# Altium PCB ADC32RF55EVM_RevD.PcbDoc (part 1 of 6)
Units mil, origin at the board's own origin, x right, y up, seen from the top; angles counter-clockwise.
Board outline 4190 x 2750 mil, 14 copper layers (Top Copper, Layer 2 (GND1), Layer 3 (PWR1), Layer 4 (GND2, Layer 5 (PWR2), Layer 6 (GND3), Layer 7 (SIG1), Layer 8 (GND4), Layer 9 (GND5), Layer 10 (SIG2), Layer 11 (GND6), Layer 12 (PWR3), Layer 13 (GND7), Bottom Copper), stack 58.6 mil thick; 427 components, 558 nets, 1902 pads, 1008 vias.
Unrouted connection lines stored in the file: 51.
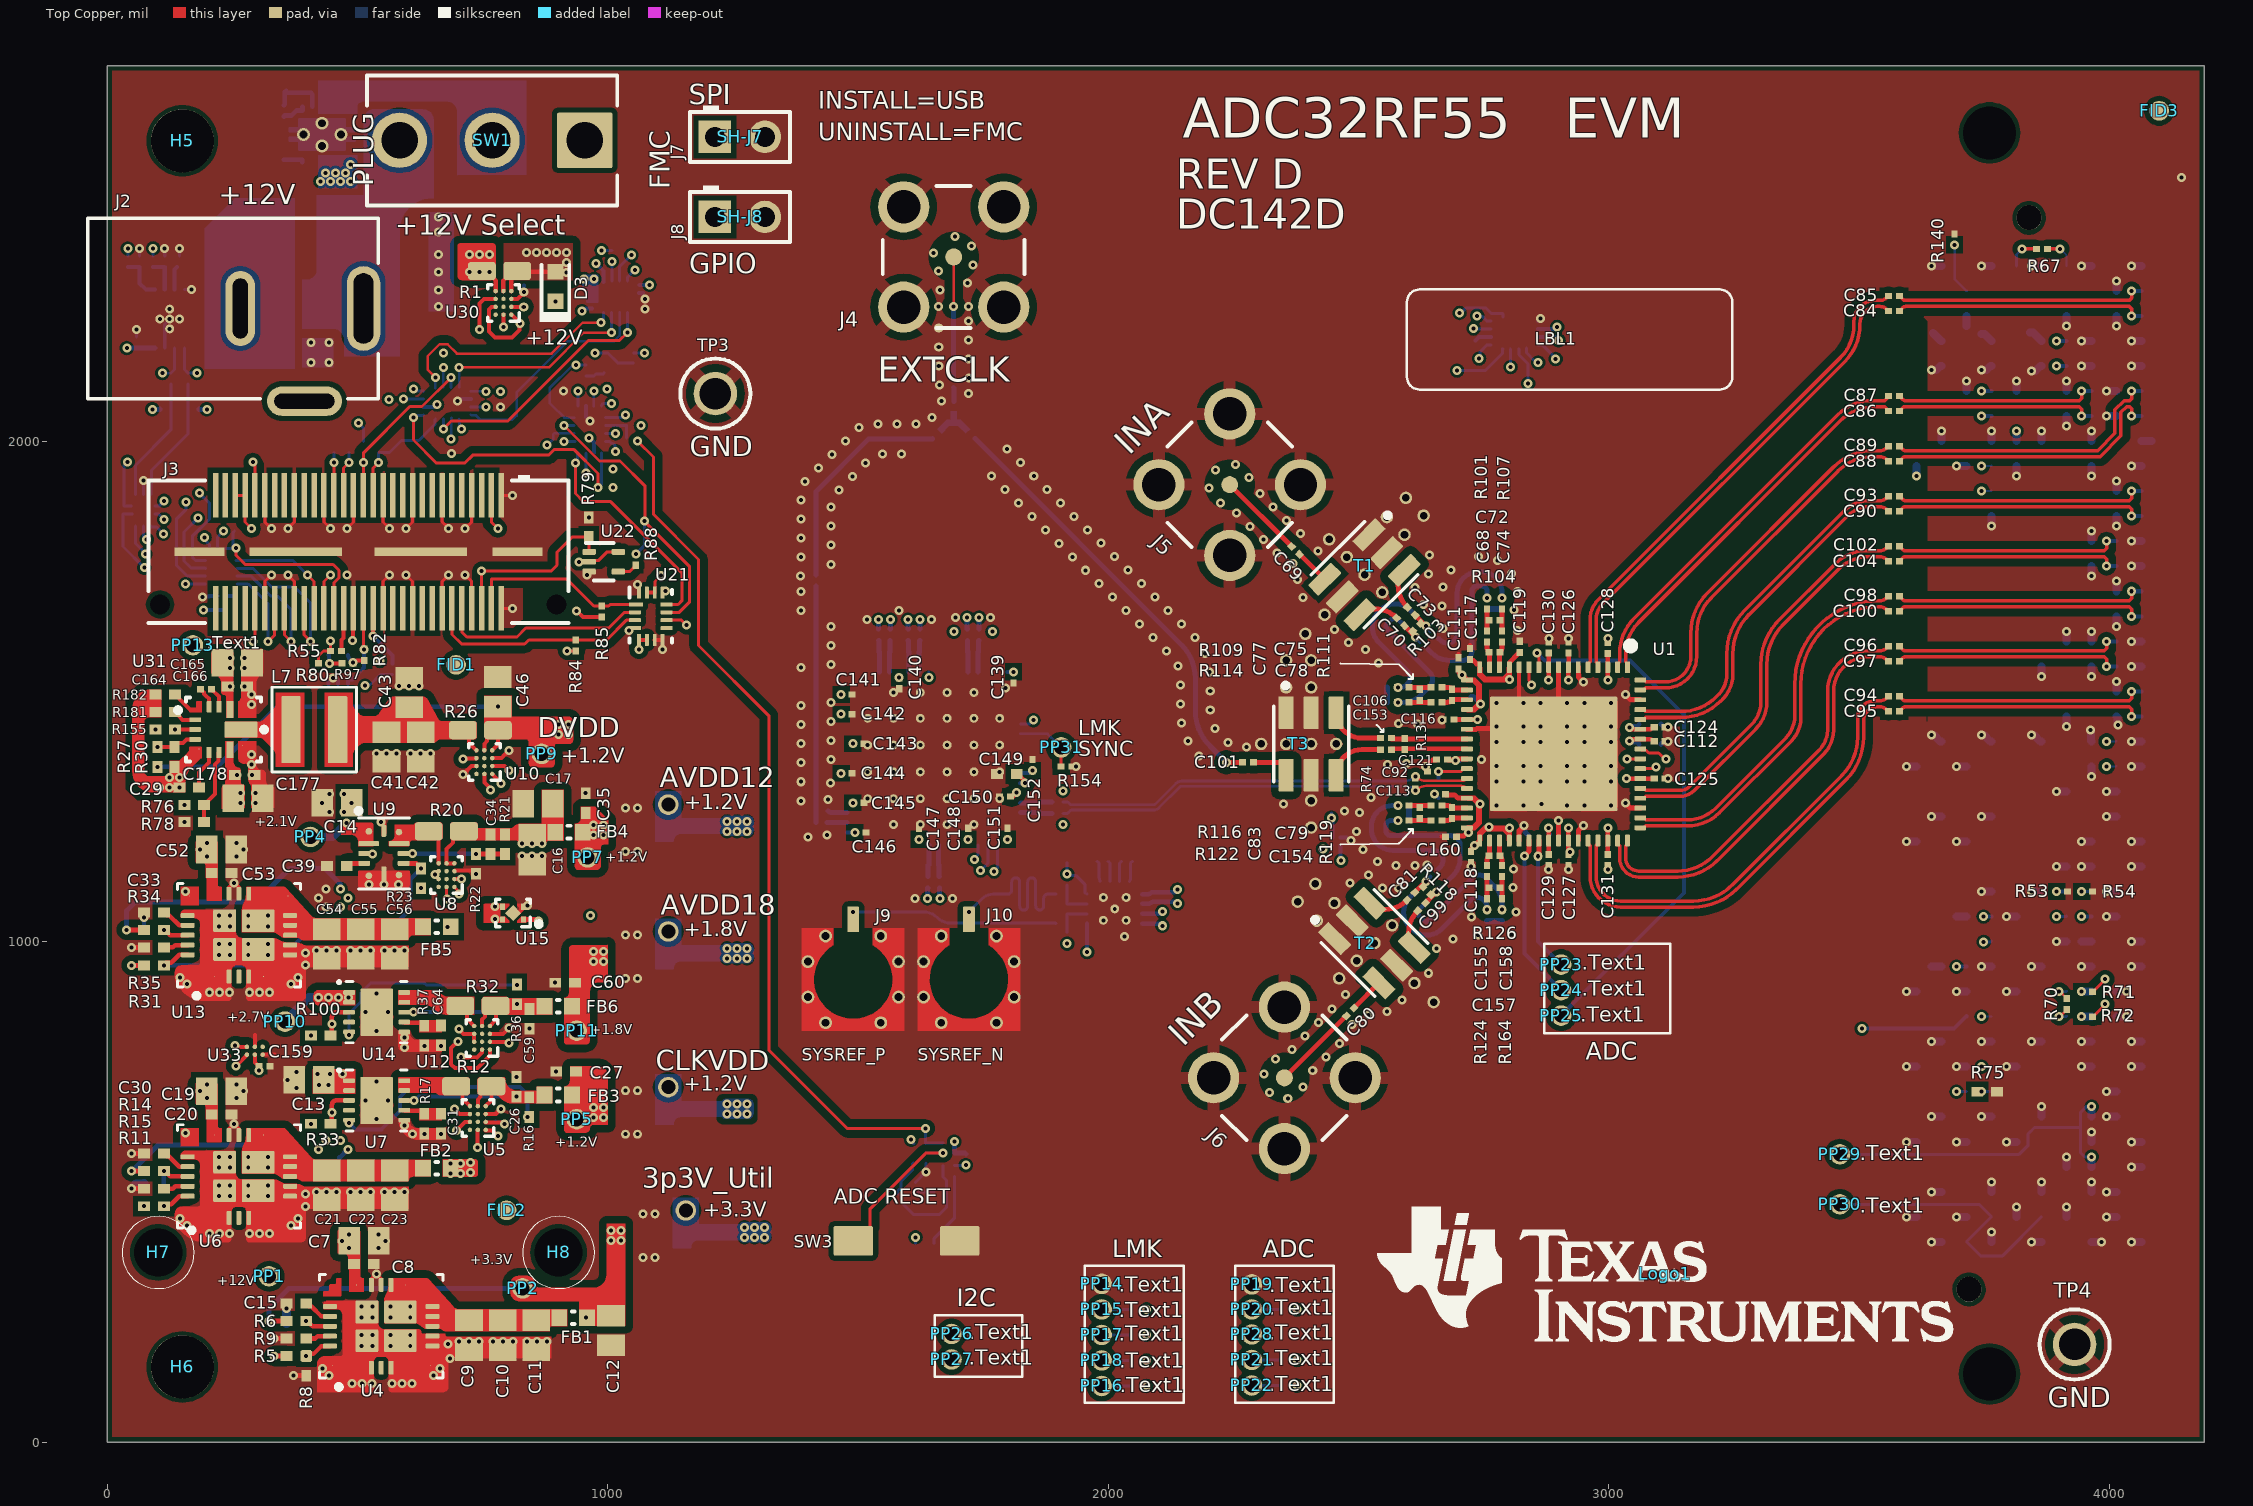
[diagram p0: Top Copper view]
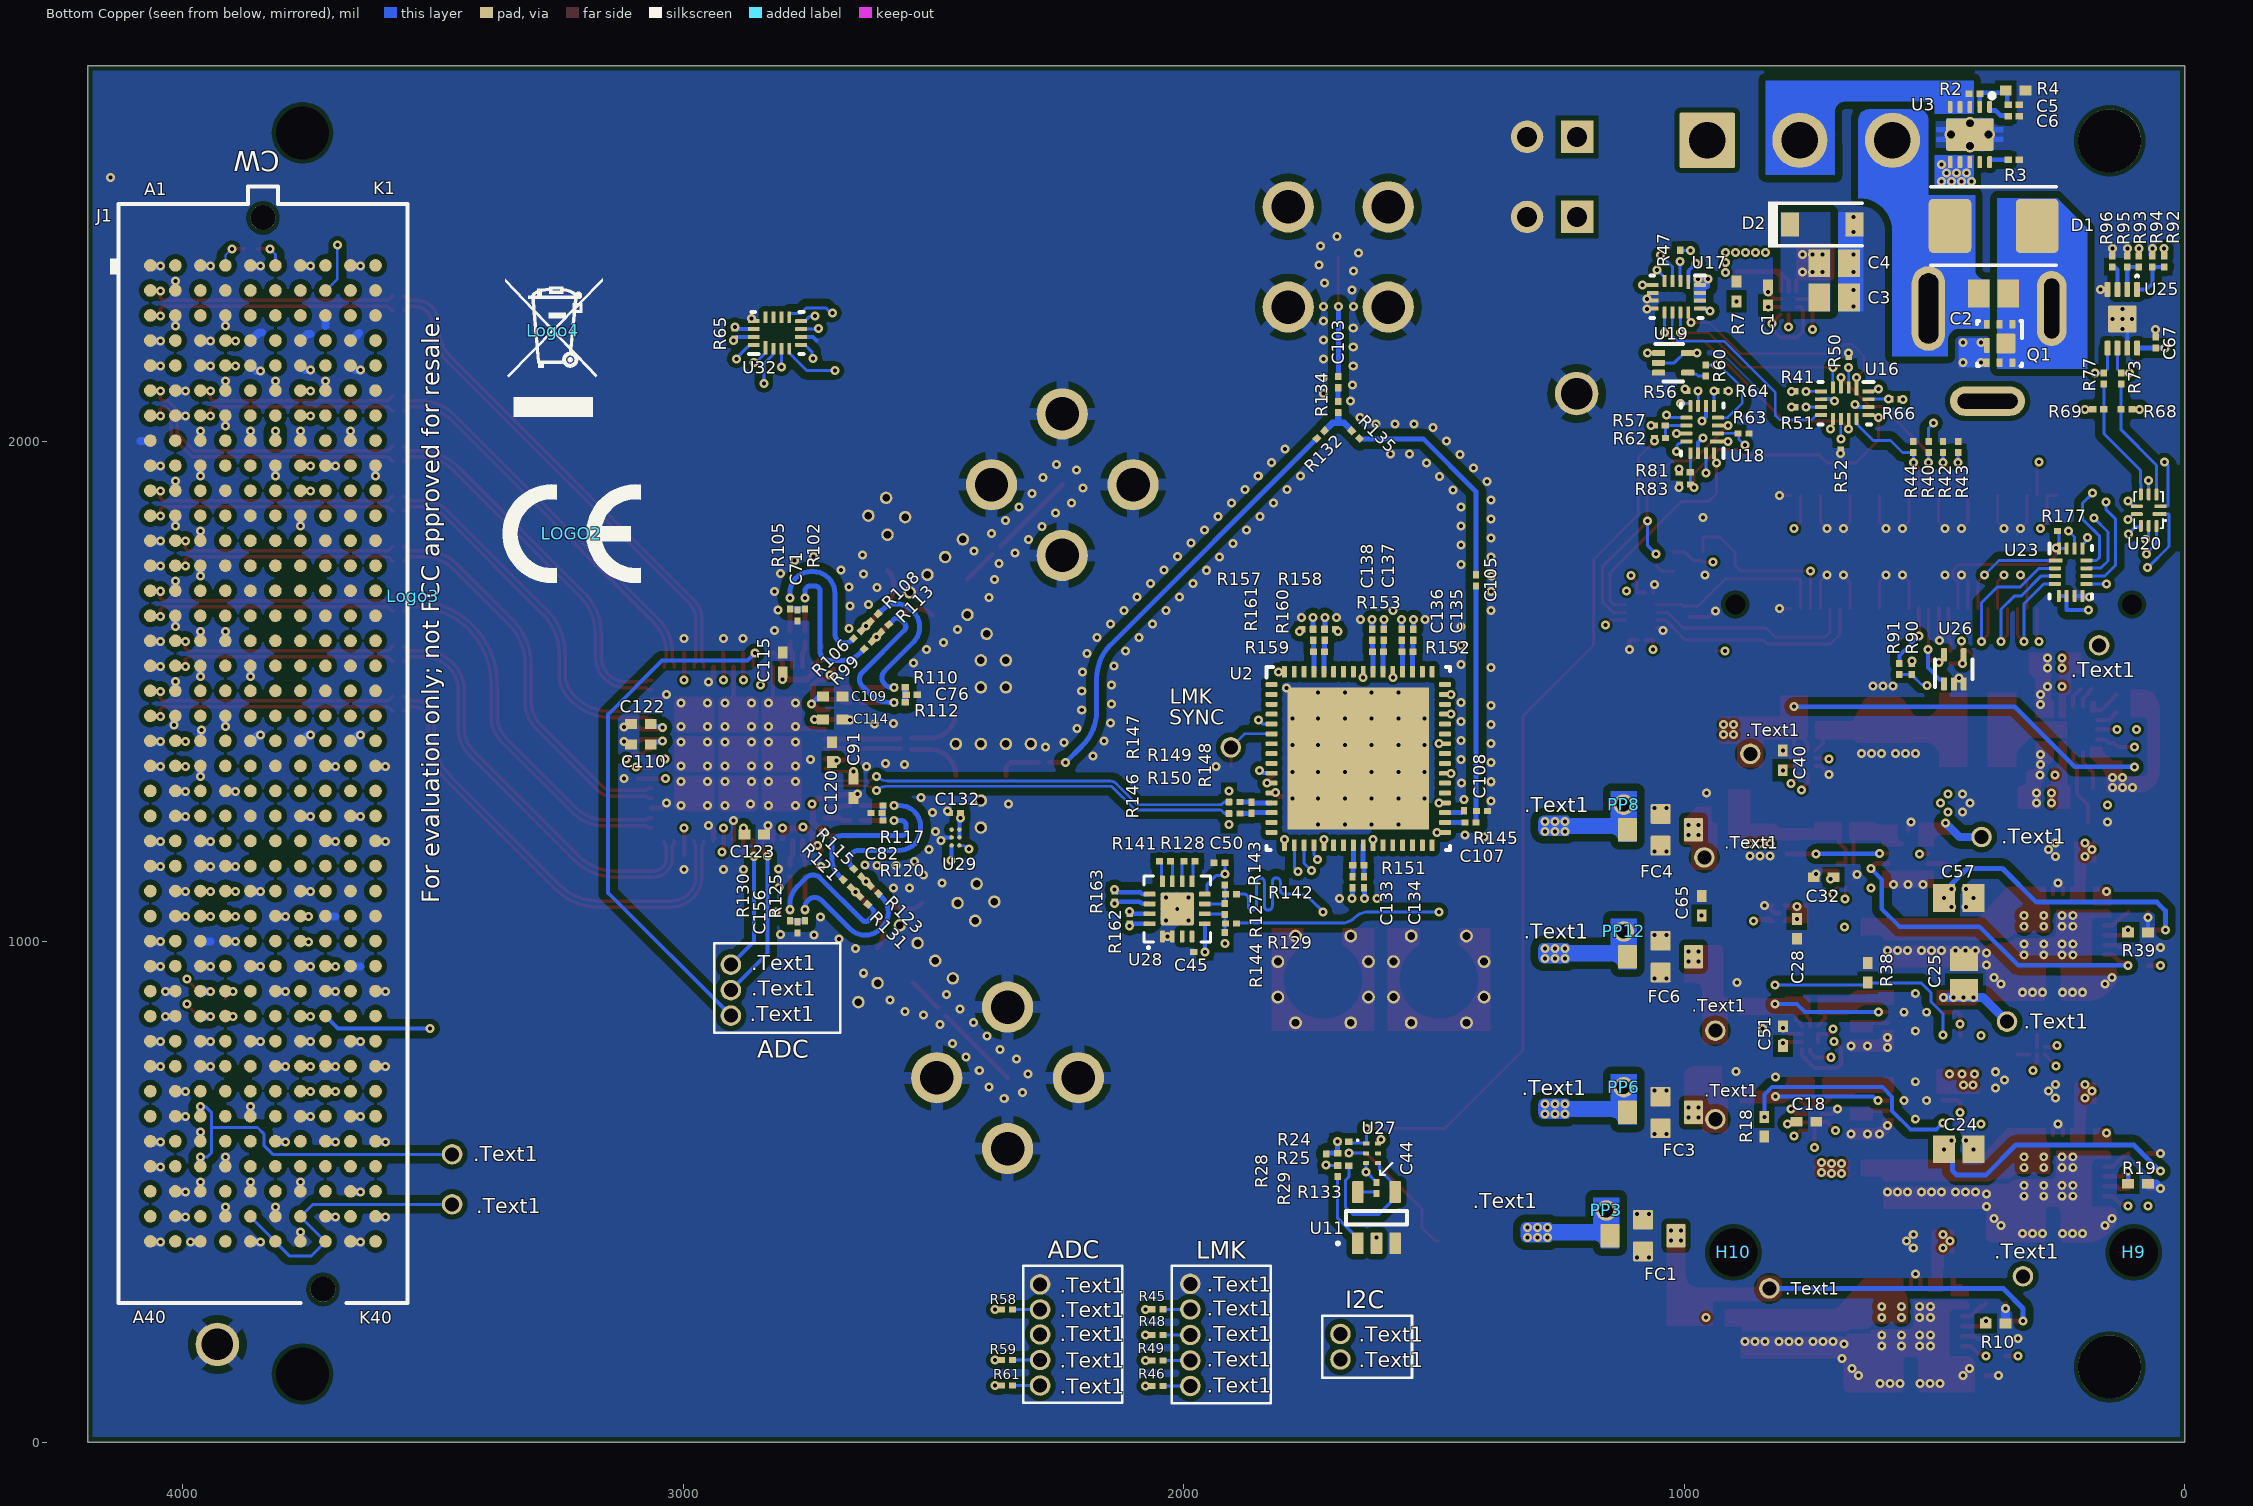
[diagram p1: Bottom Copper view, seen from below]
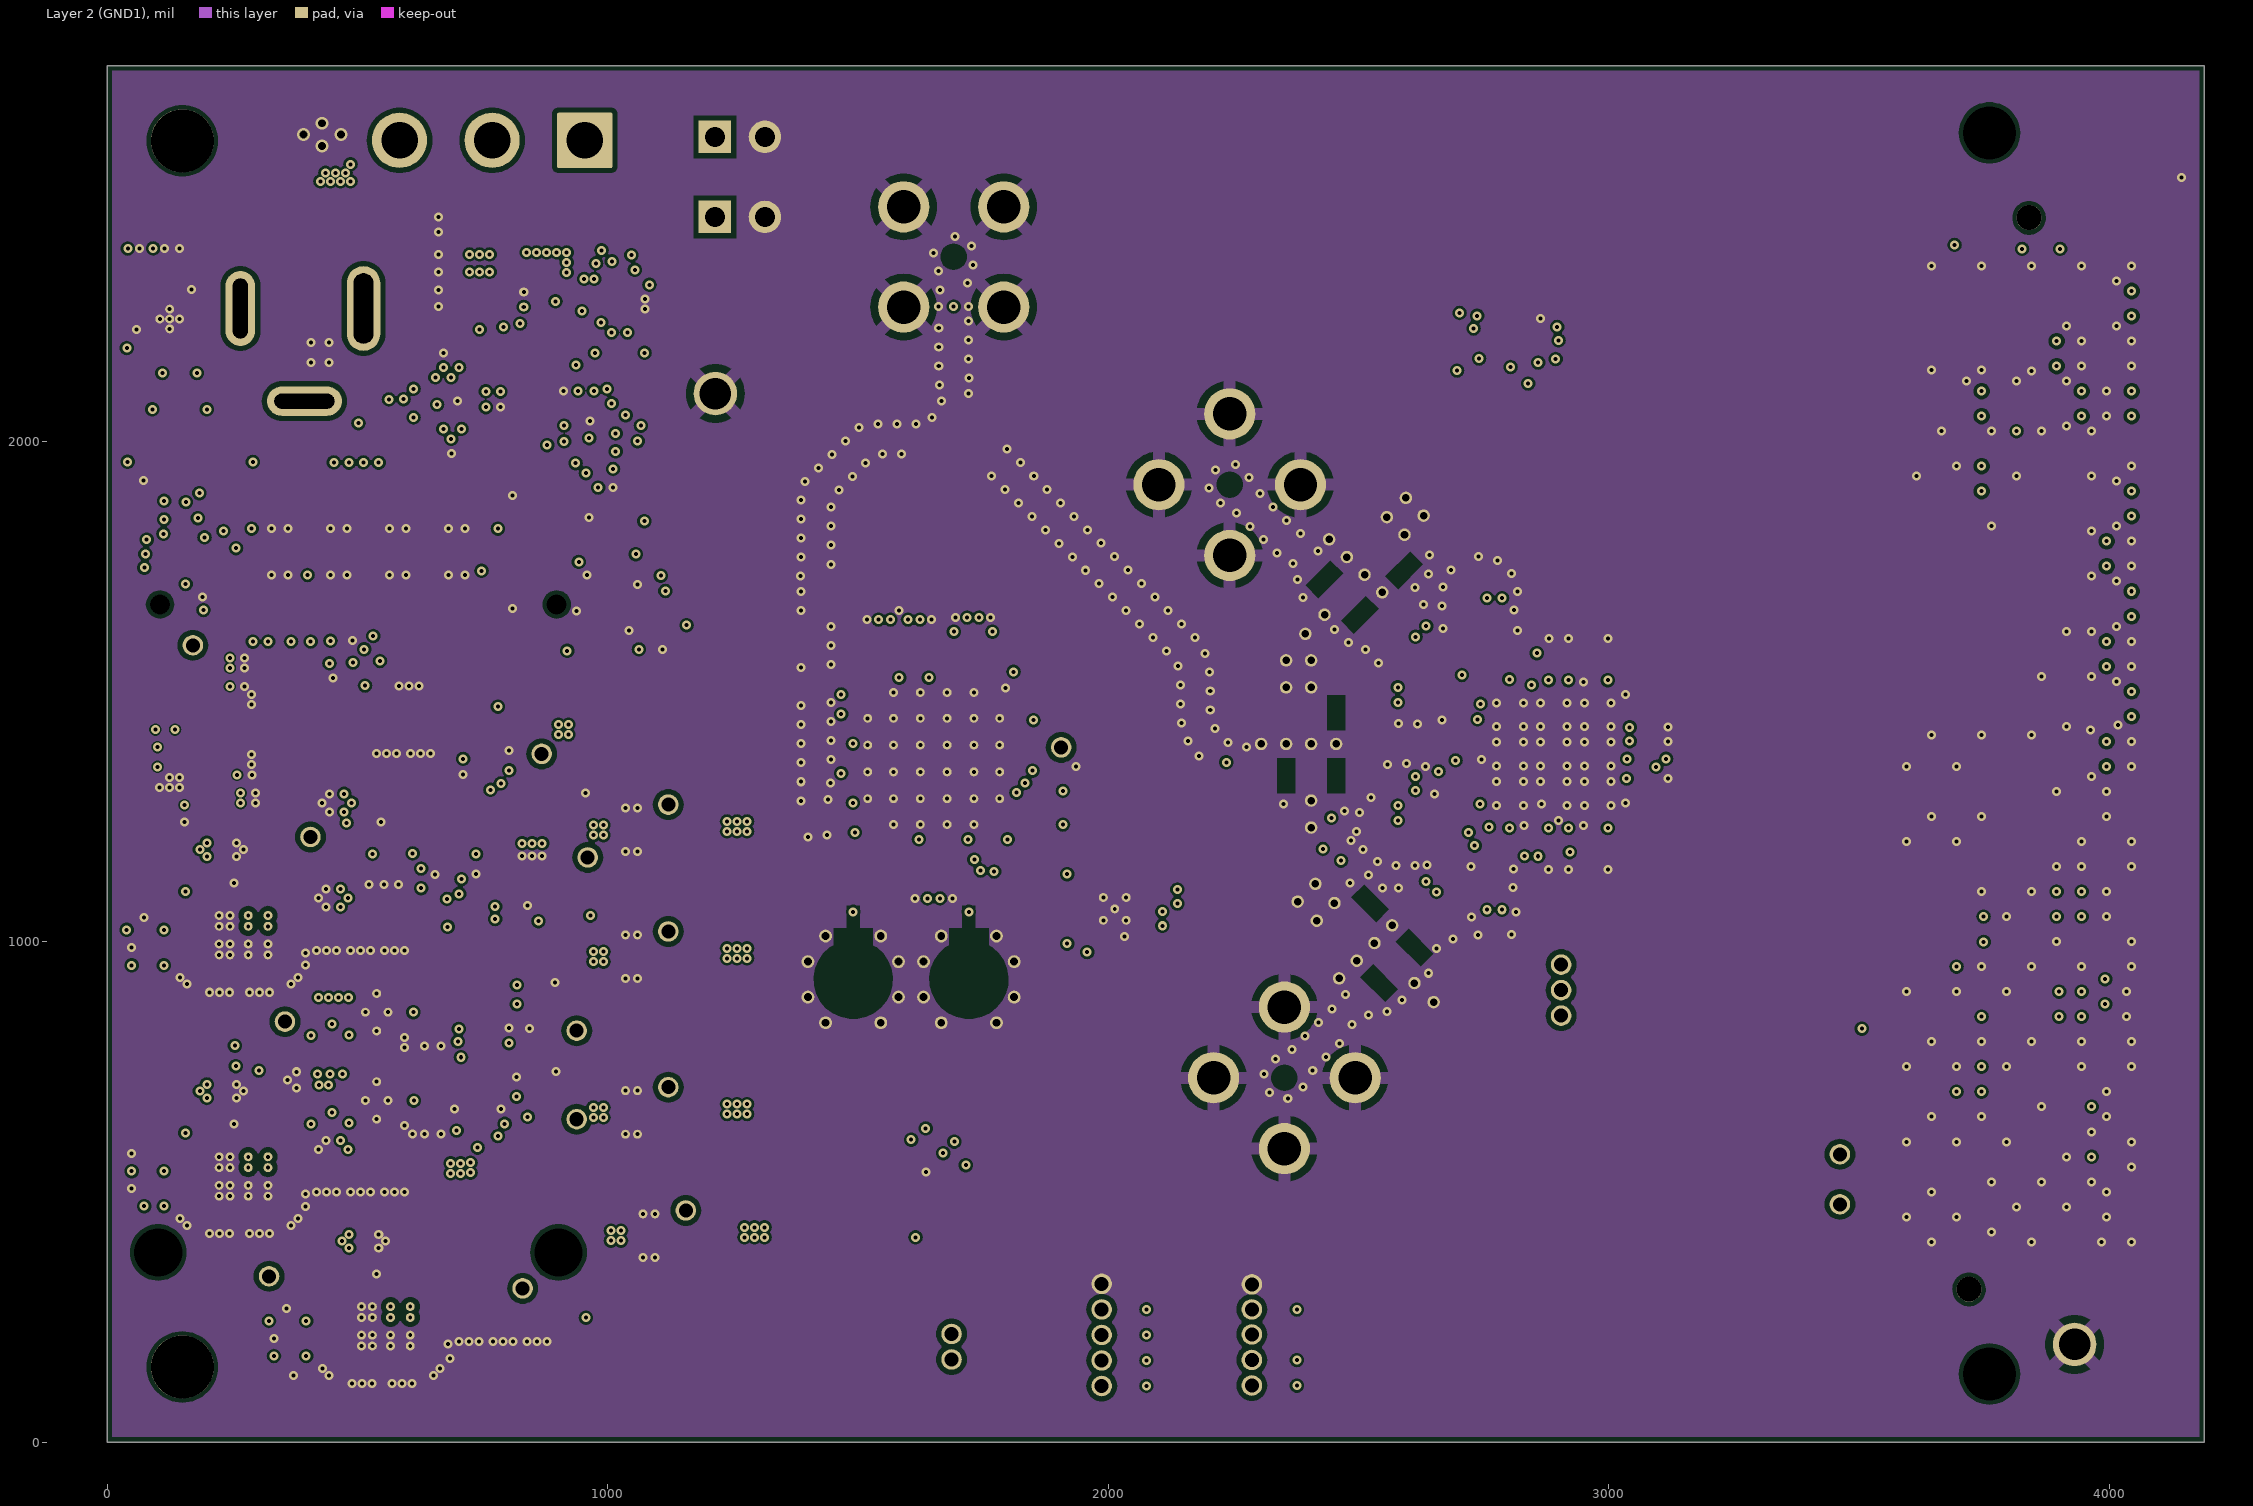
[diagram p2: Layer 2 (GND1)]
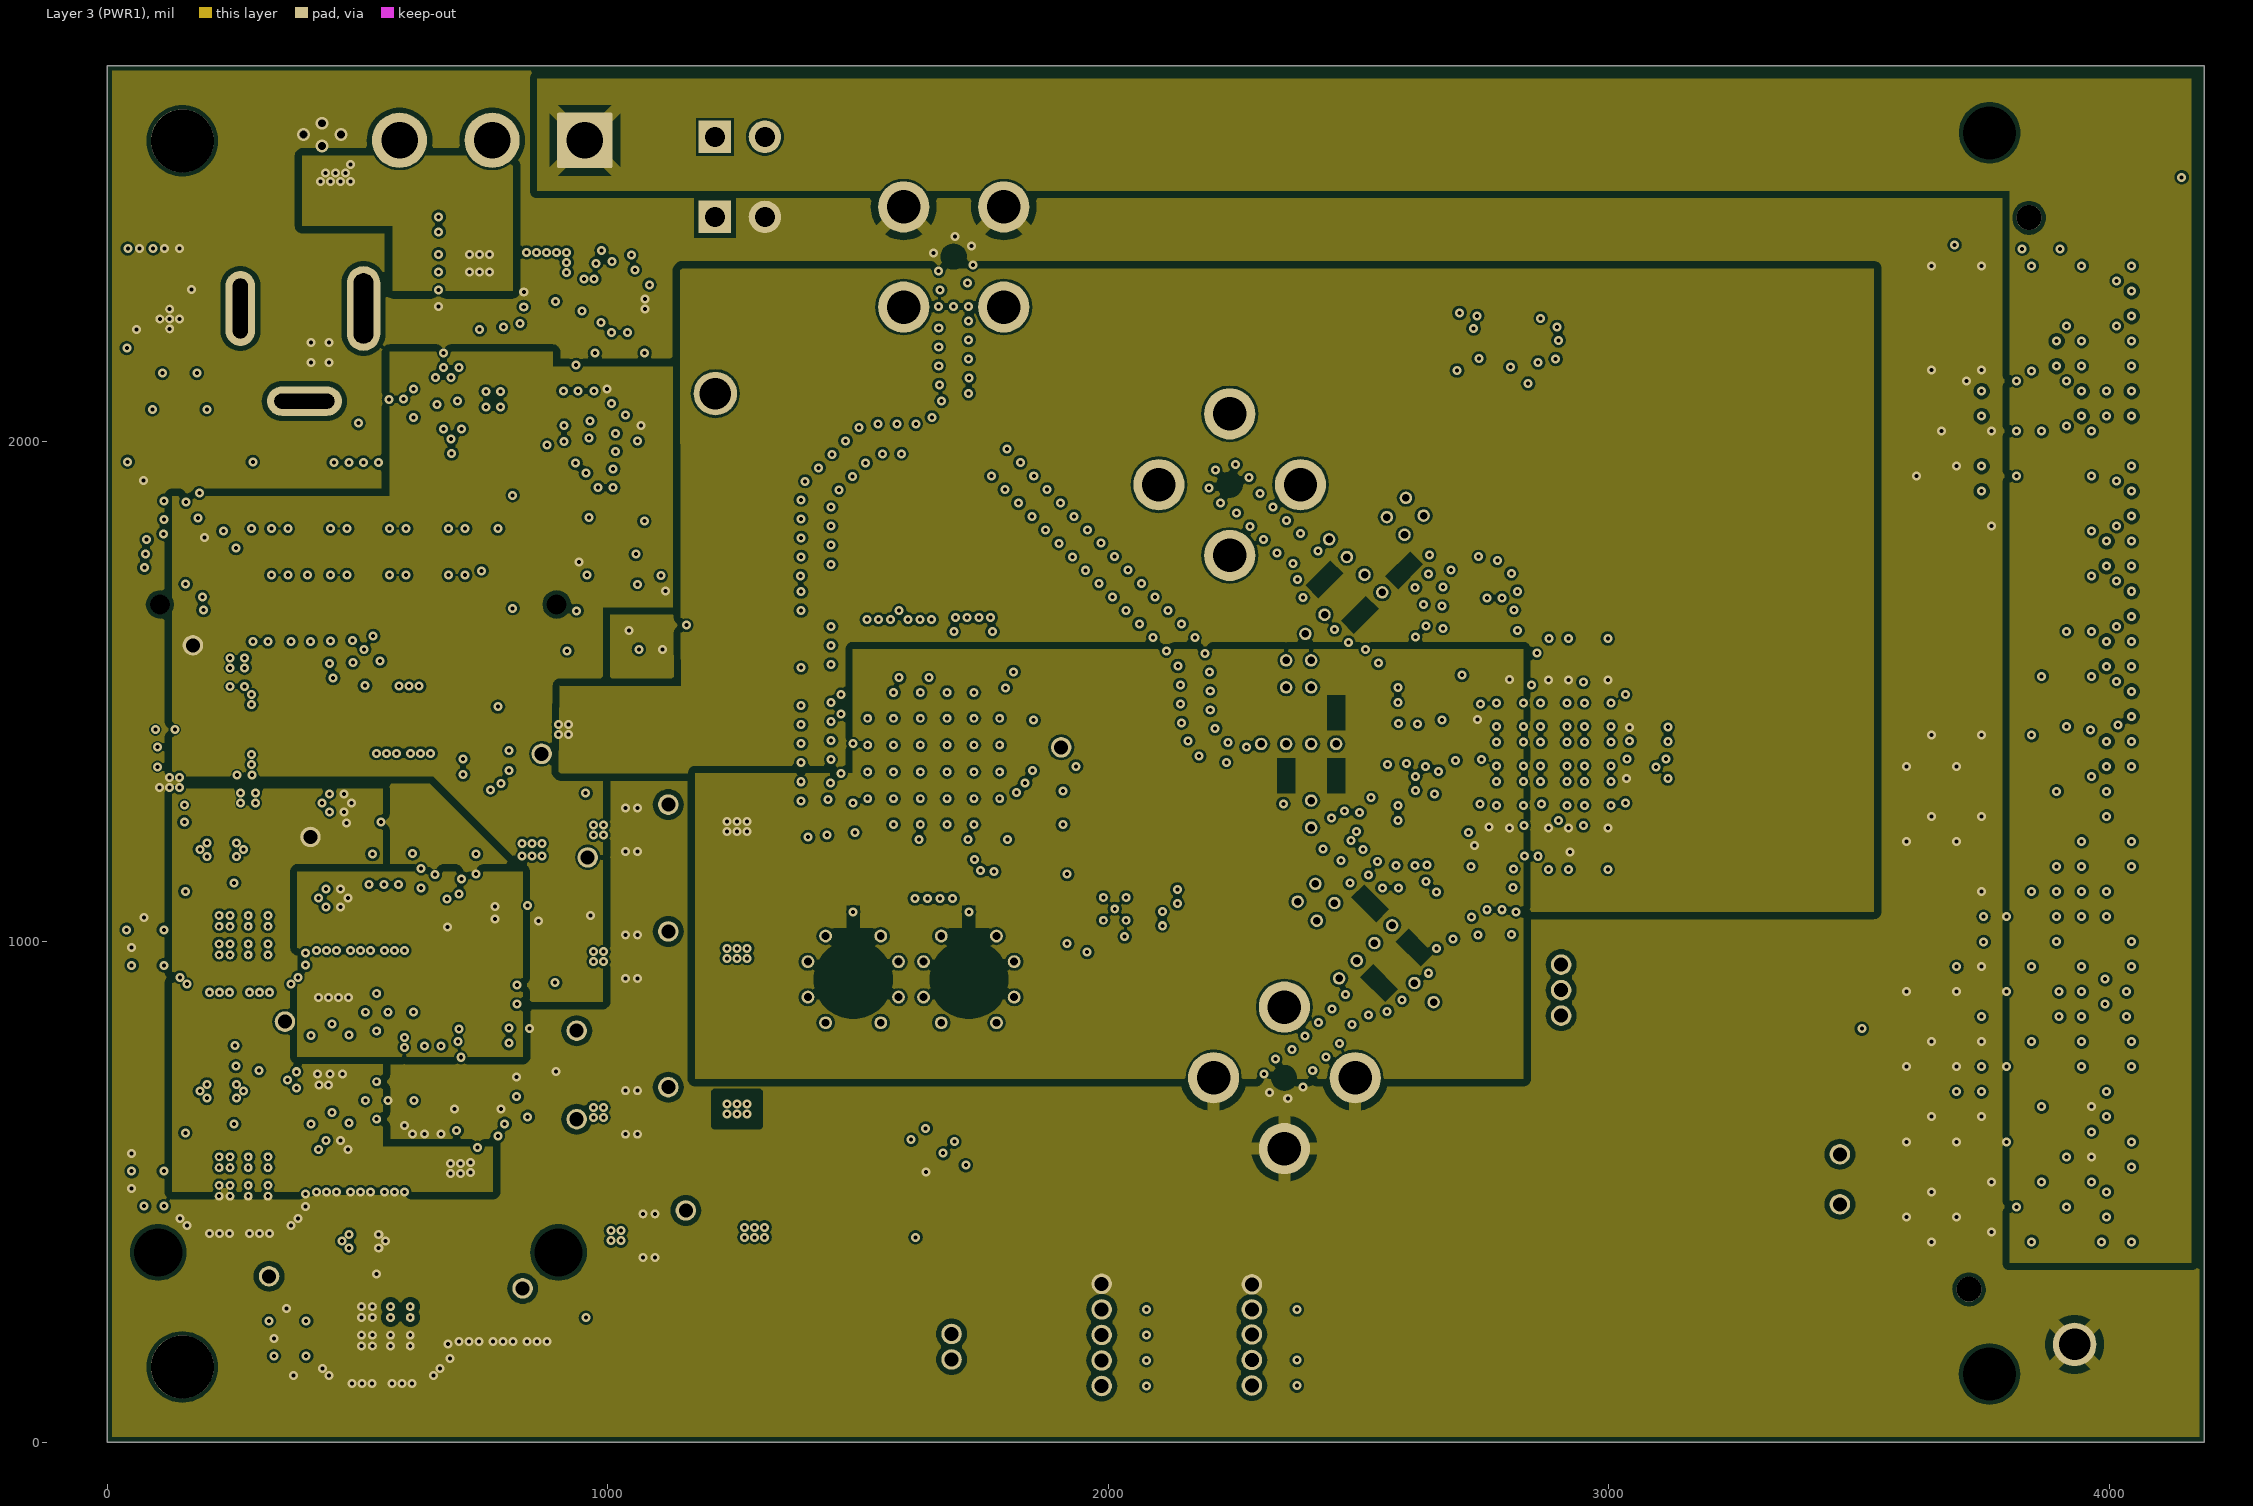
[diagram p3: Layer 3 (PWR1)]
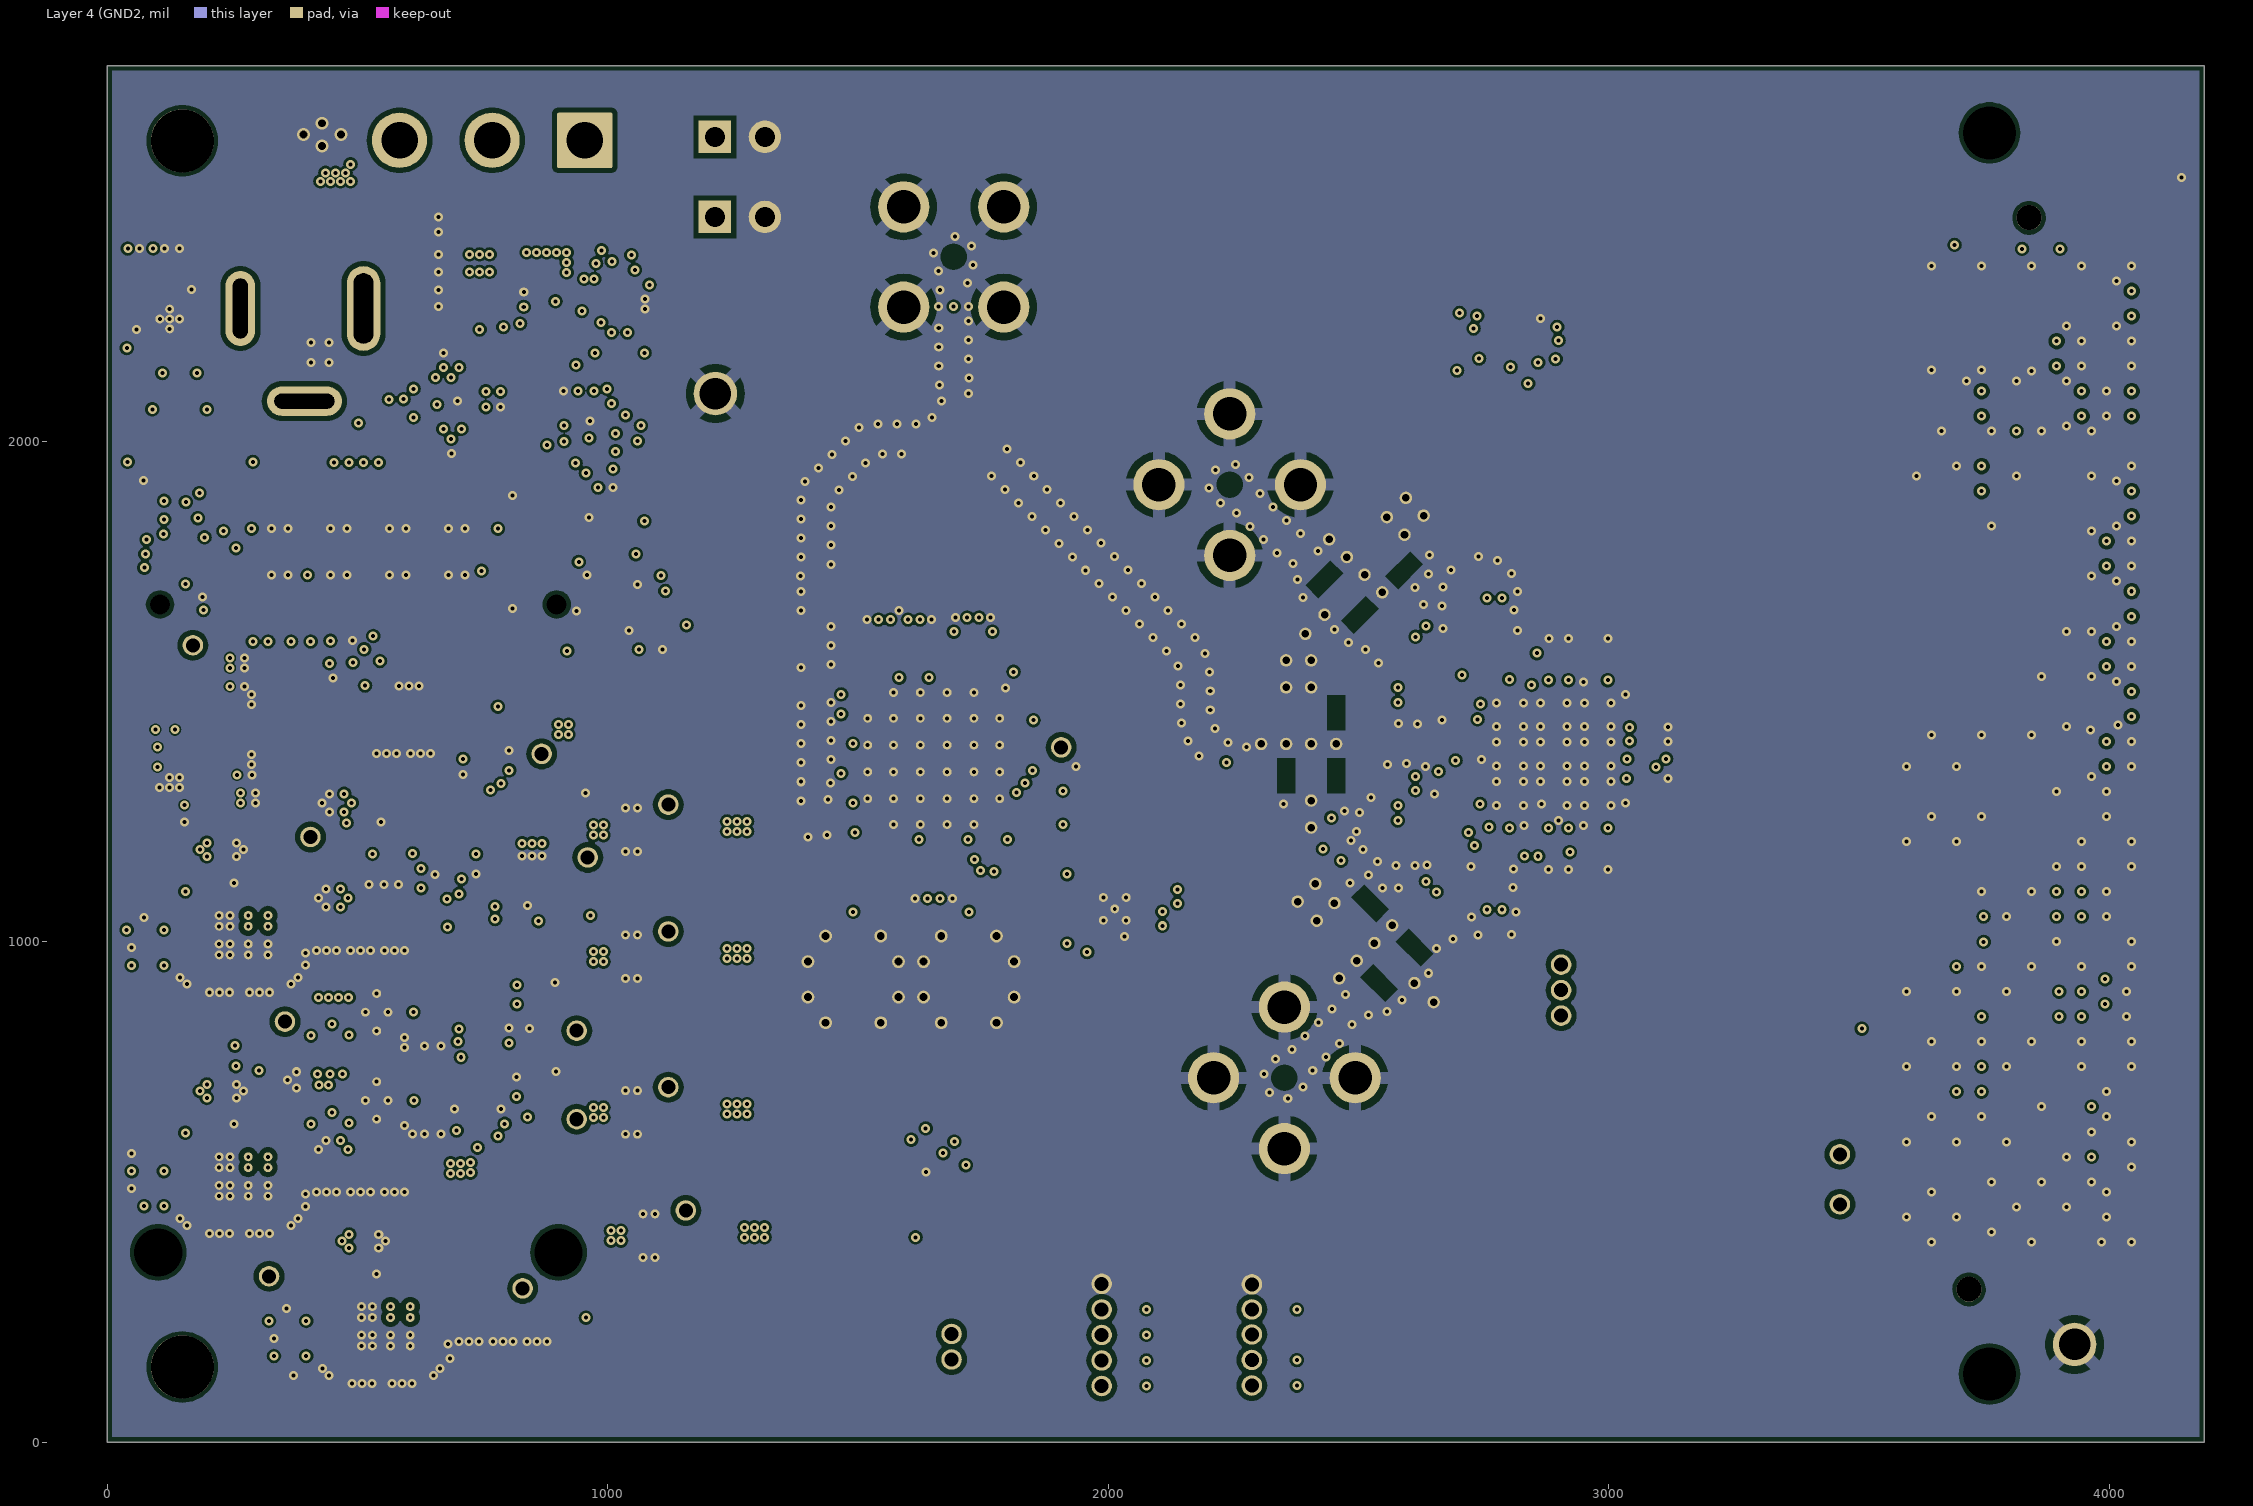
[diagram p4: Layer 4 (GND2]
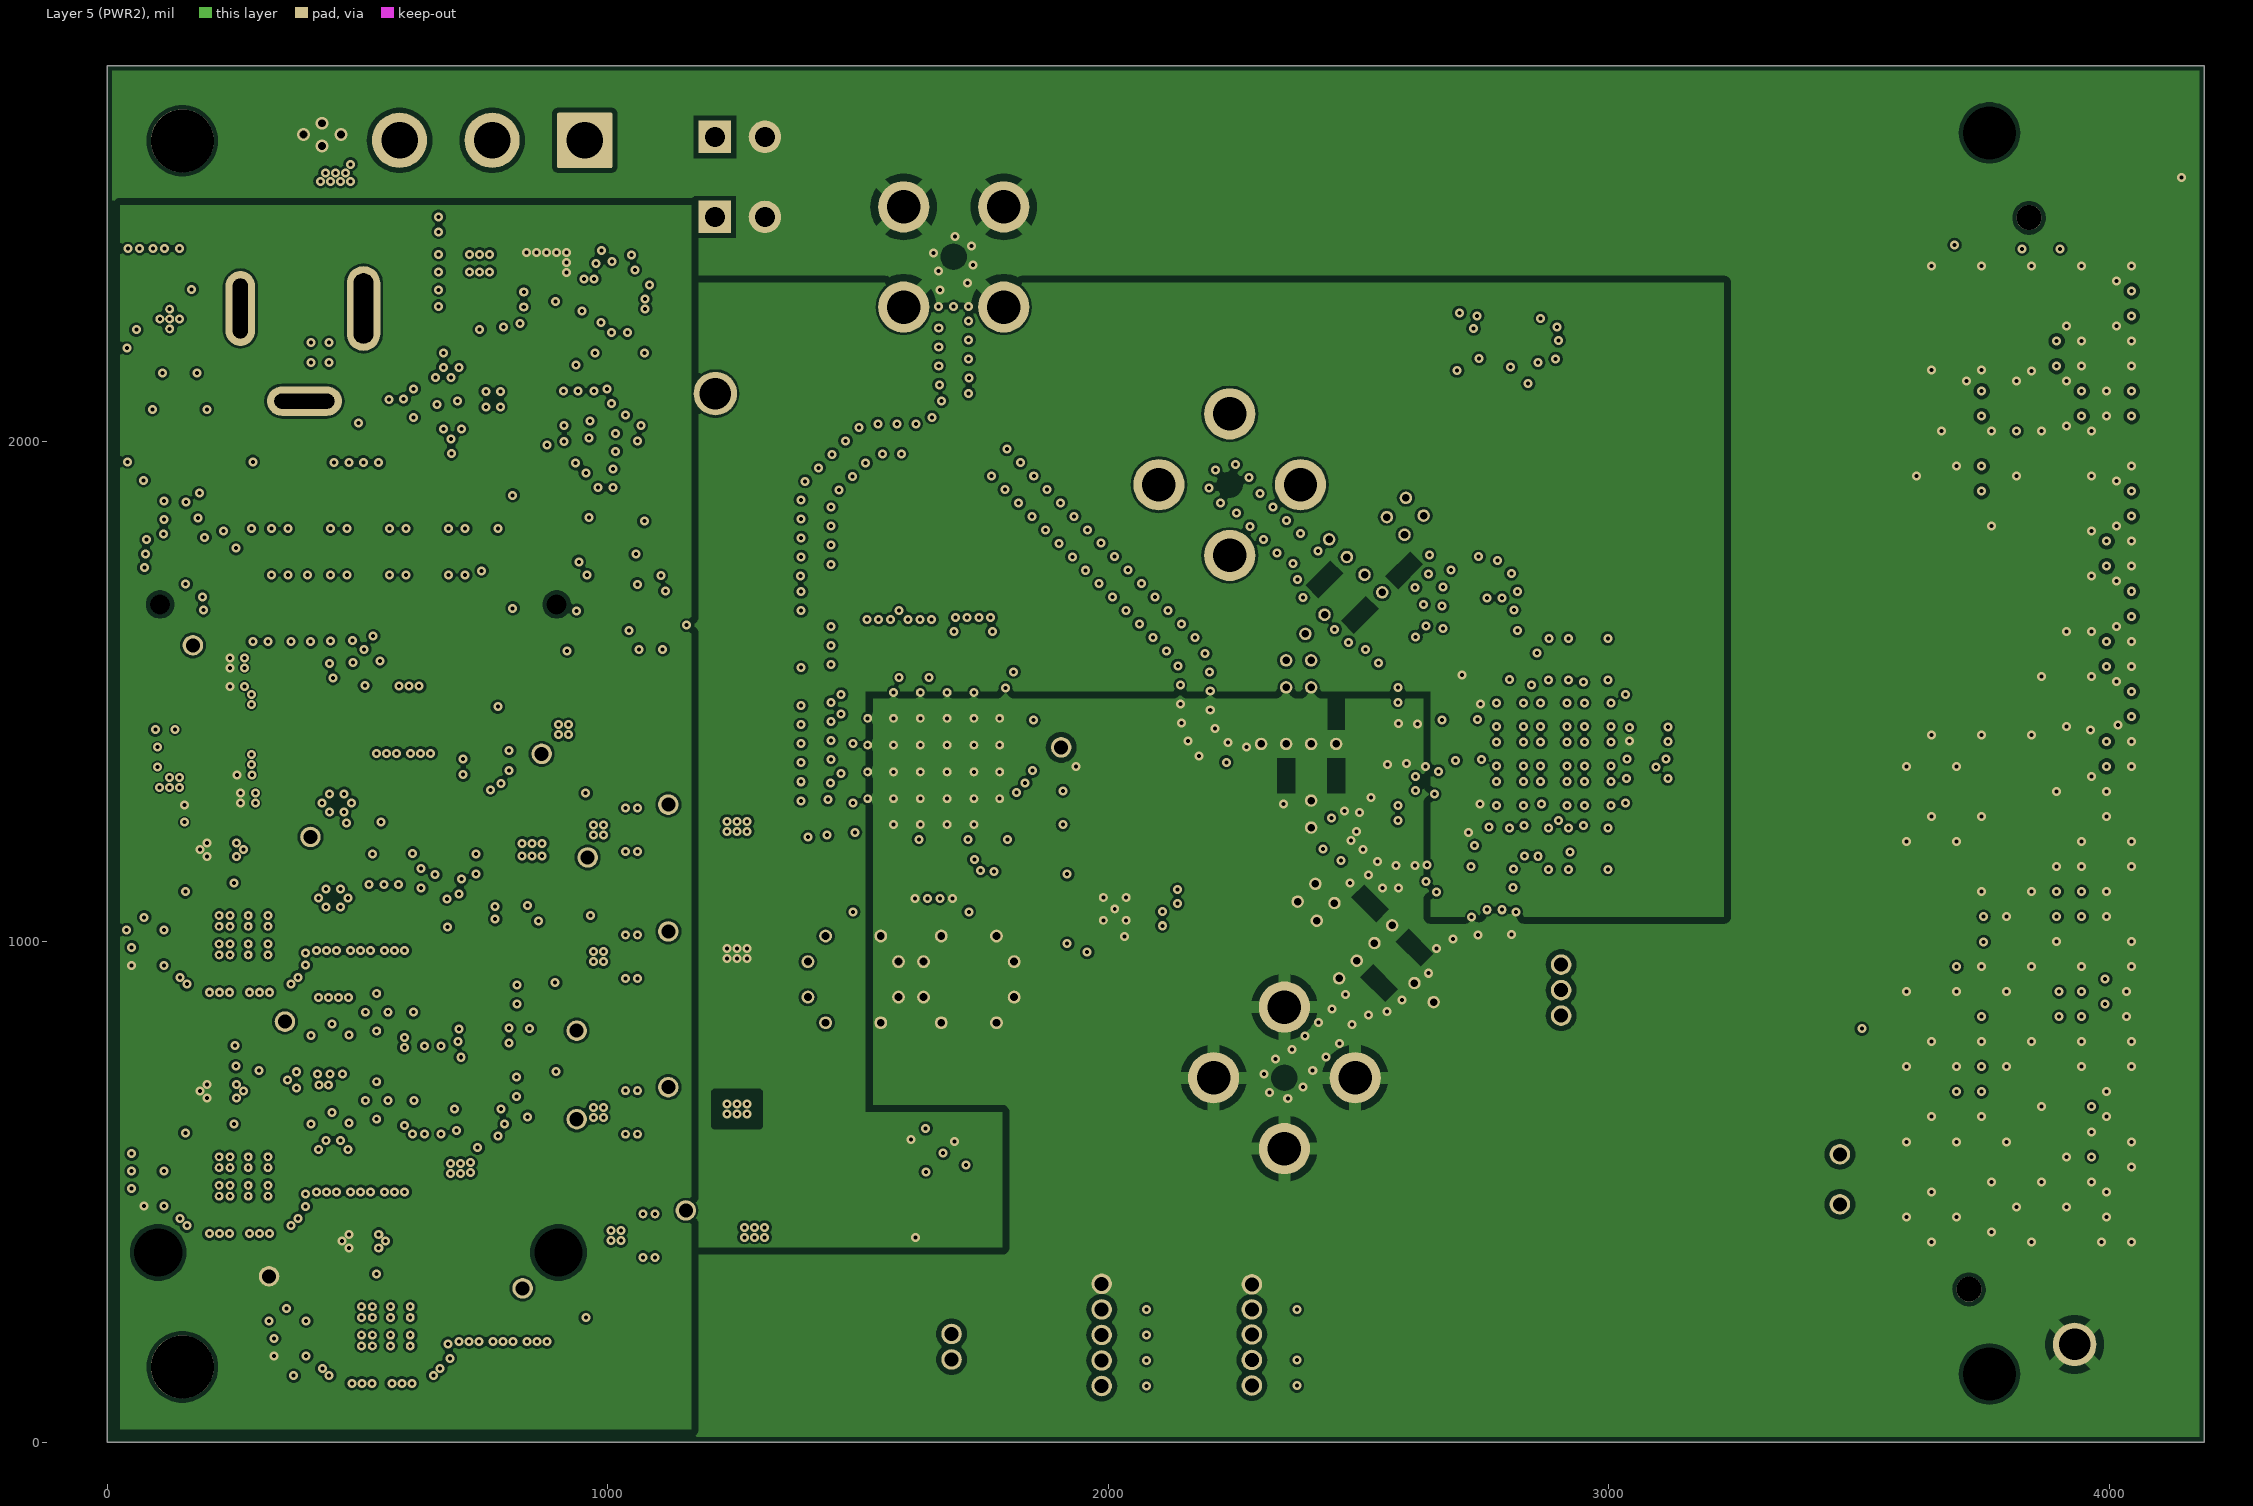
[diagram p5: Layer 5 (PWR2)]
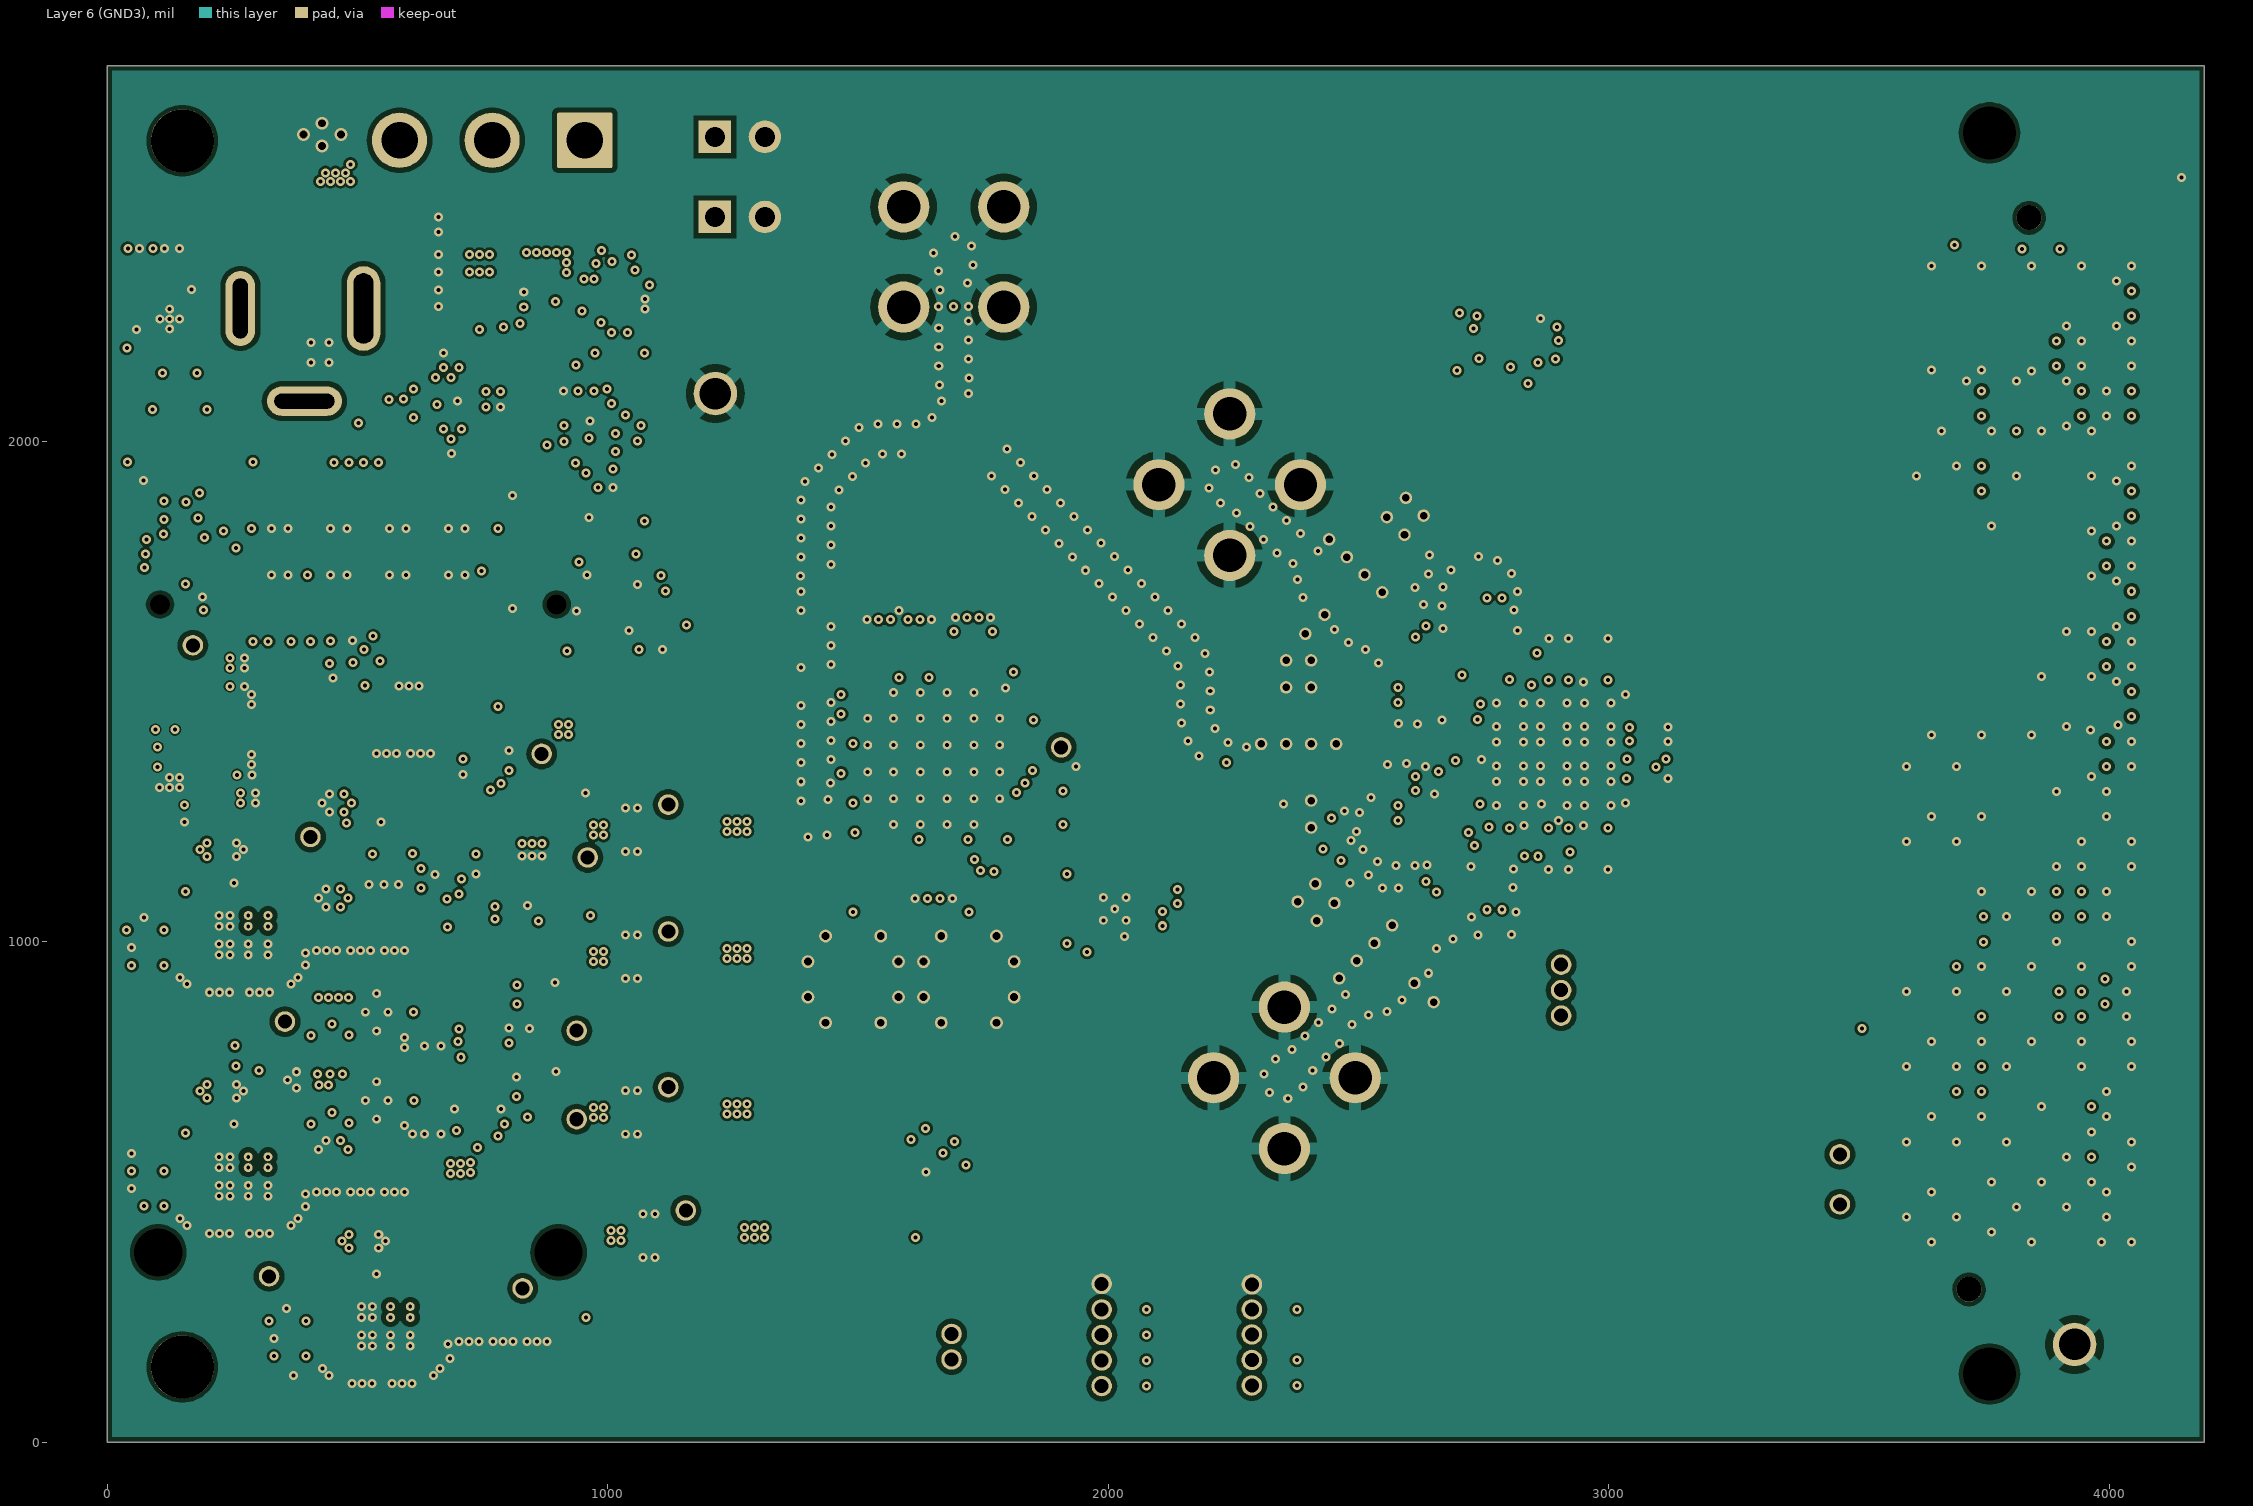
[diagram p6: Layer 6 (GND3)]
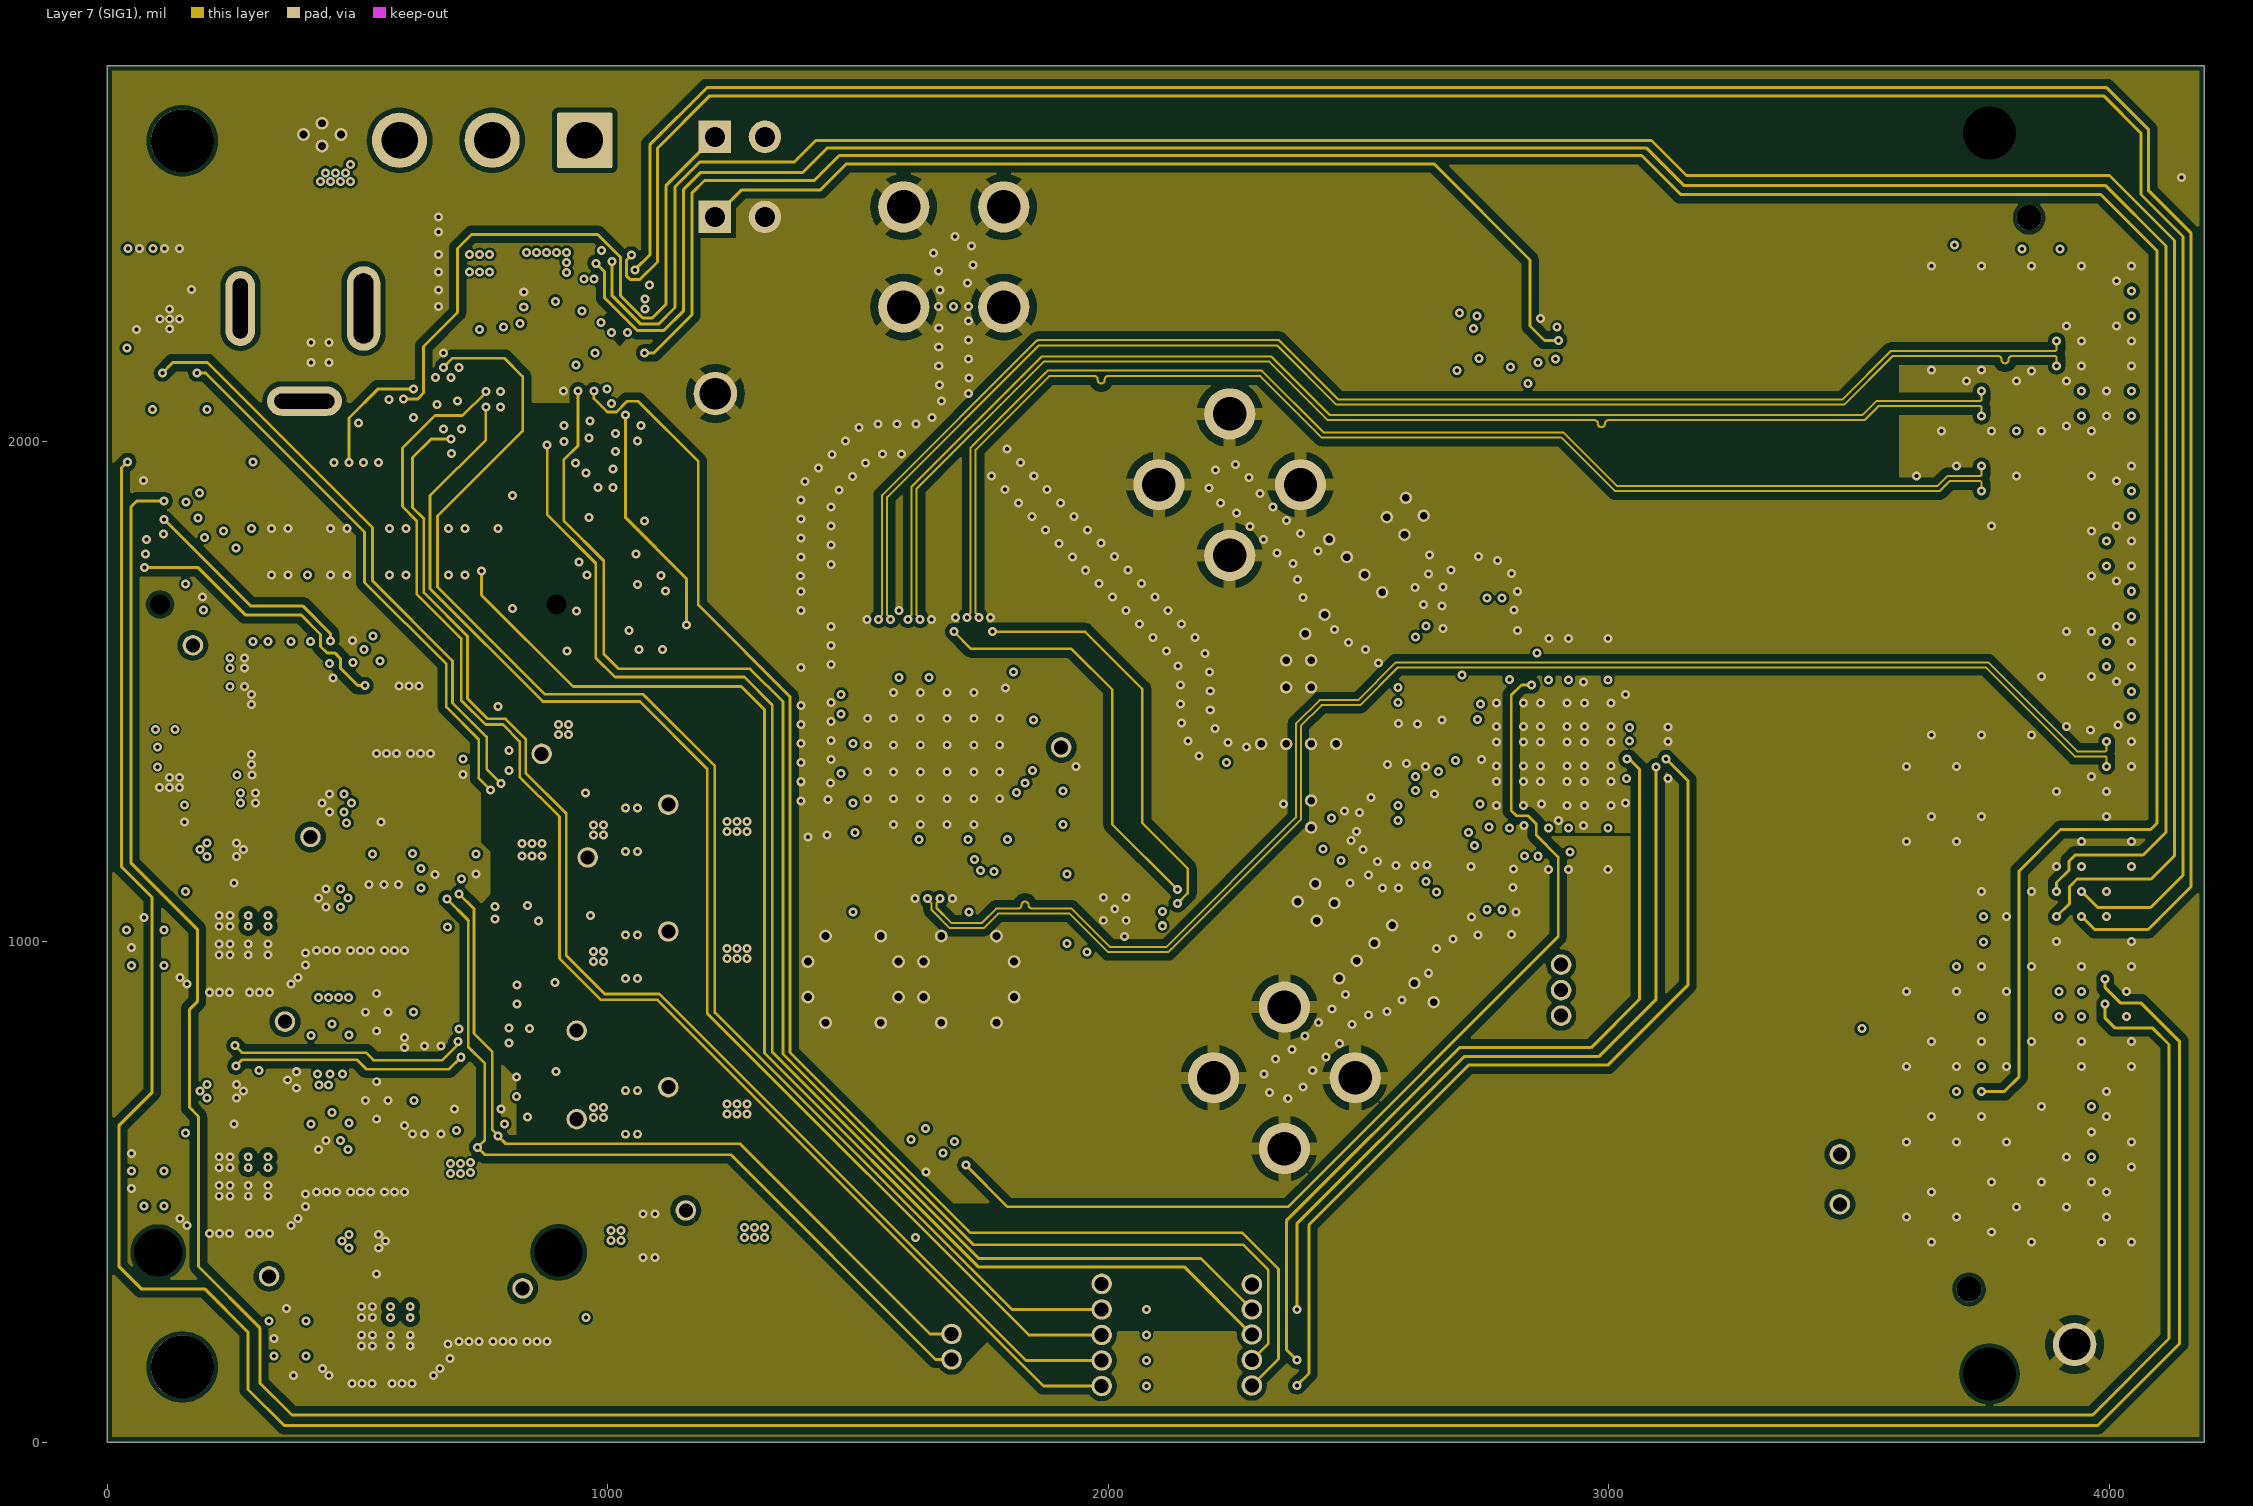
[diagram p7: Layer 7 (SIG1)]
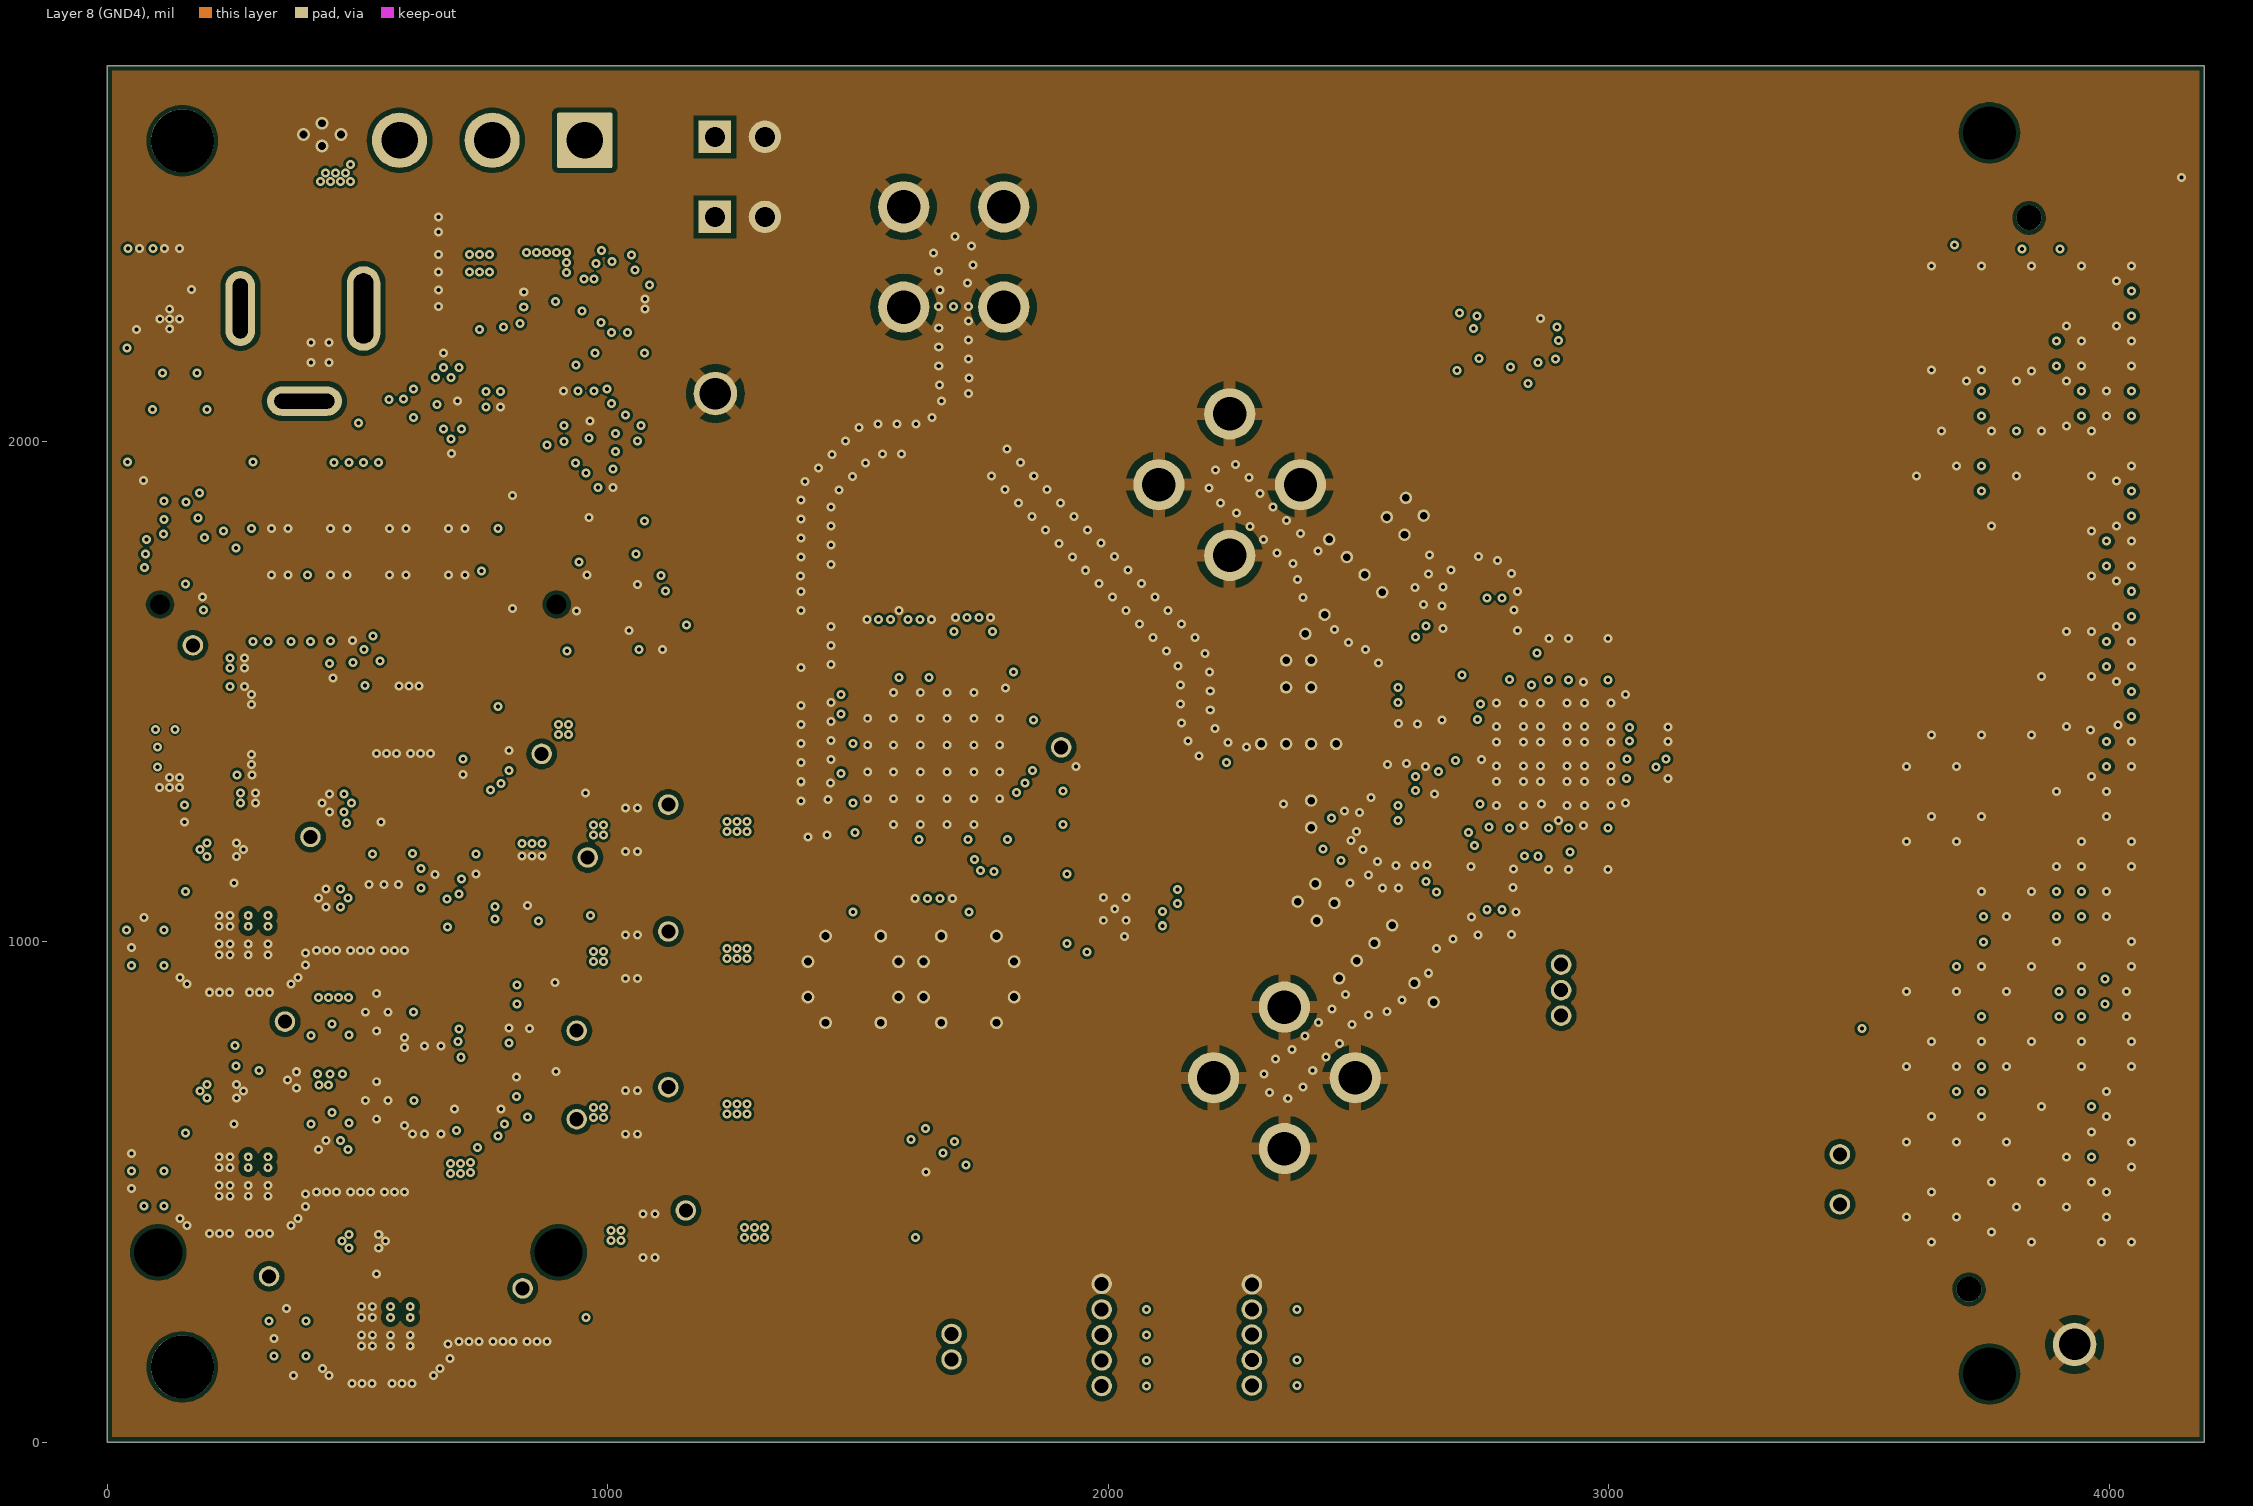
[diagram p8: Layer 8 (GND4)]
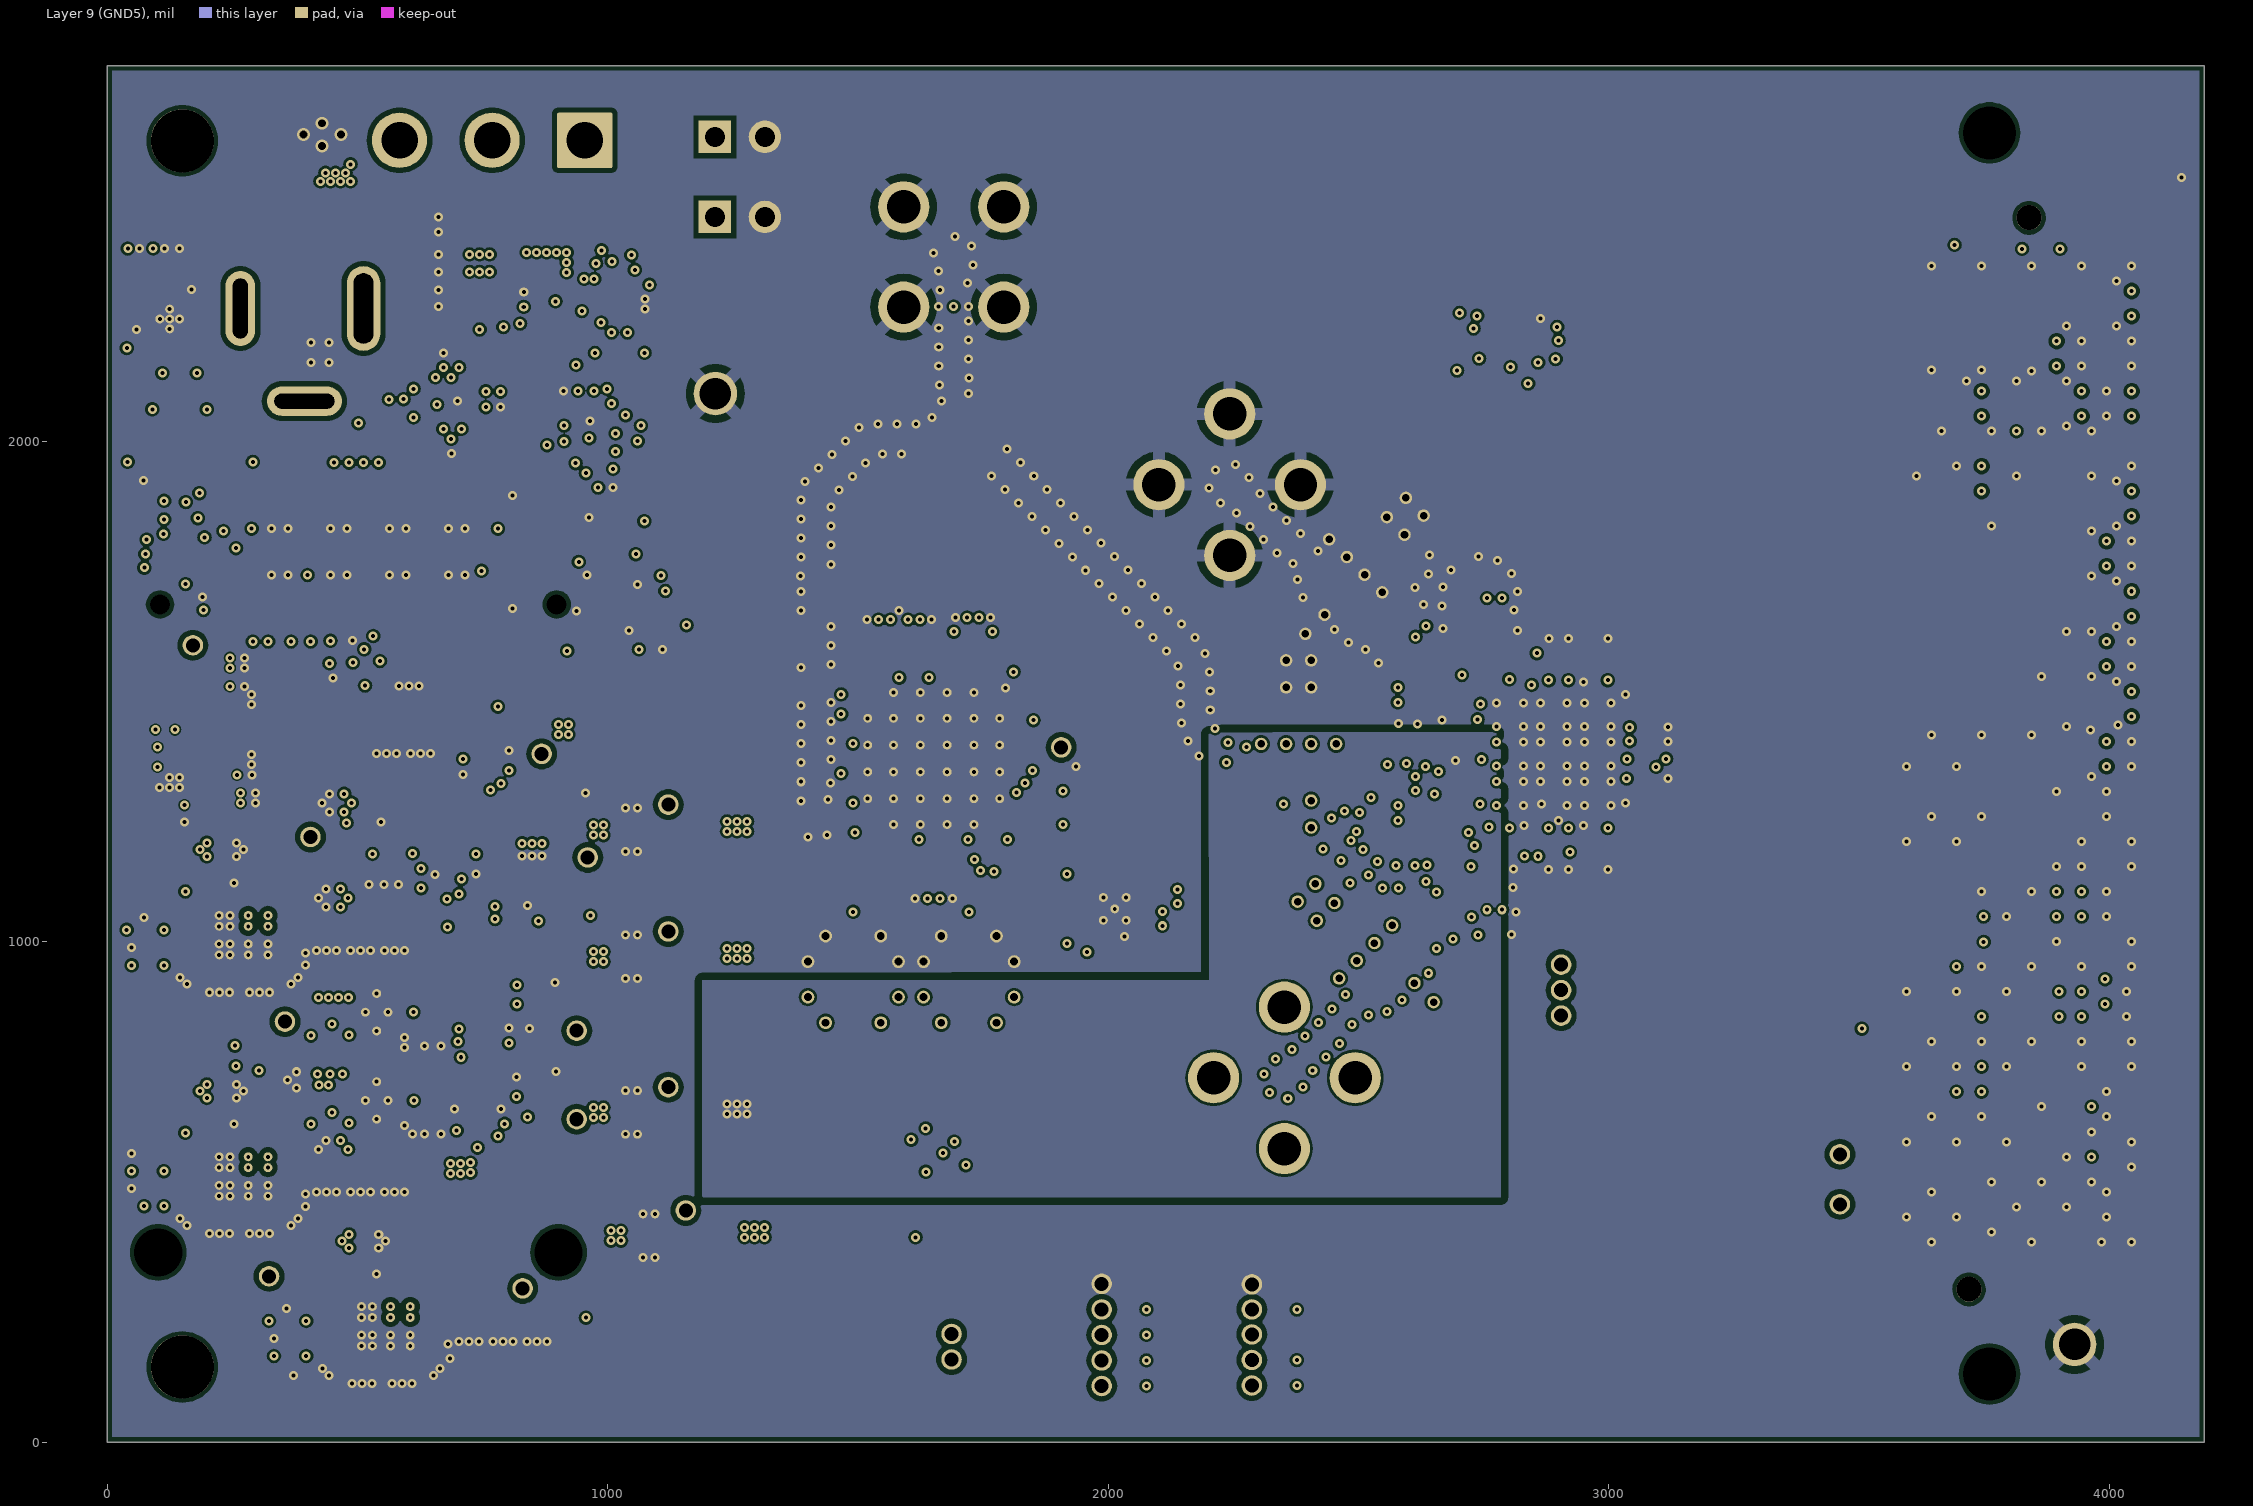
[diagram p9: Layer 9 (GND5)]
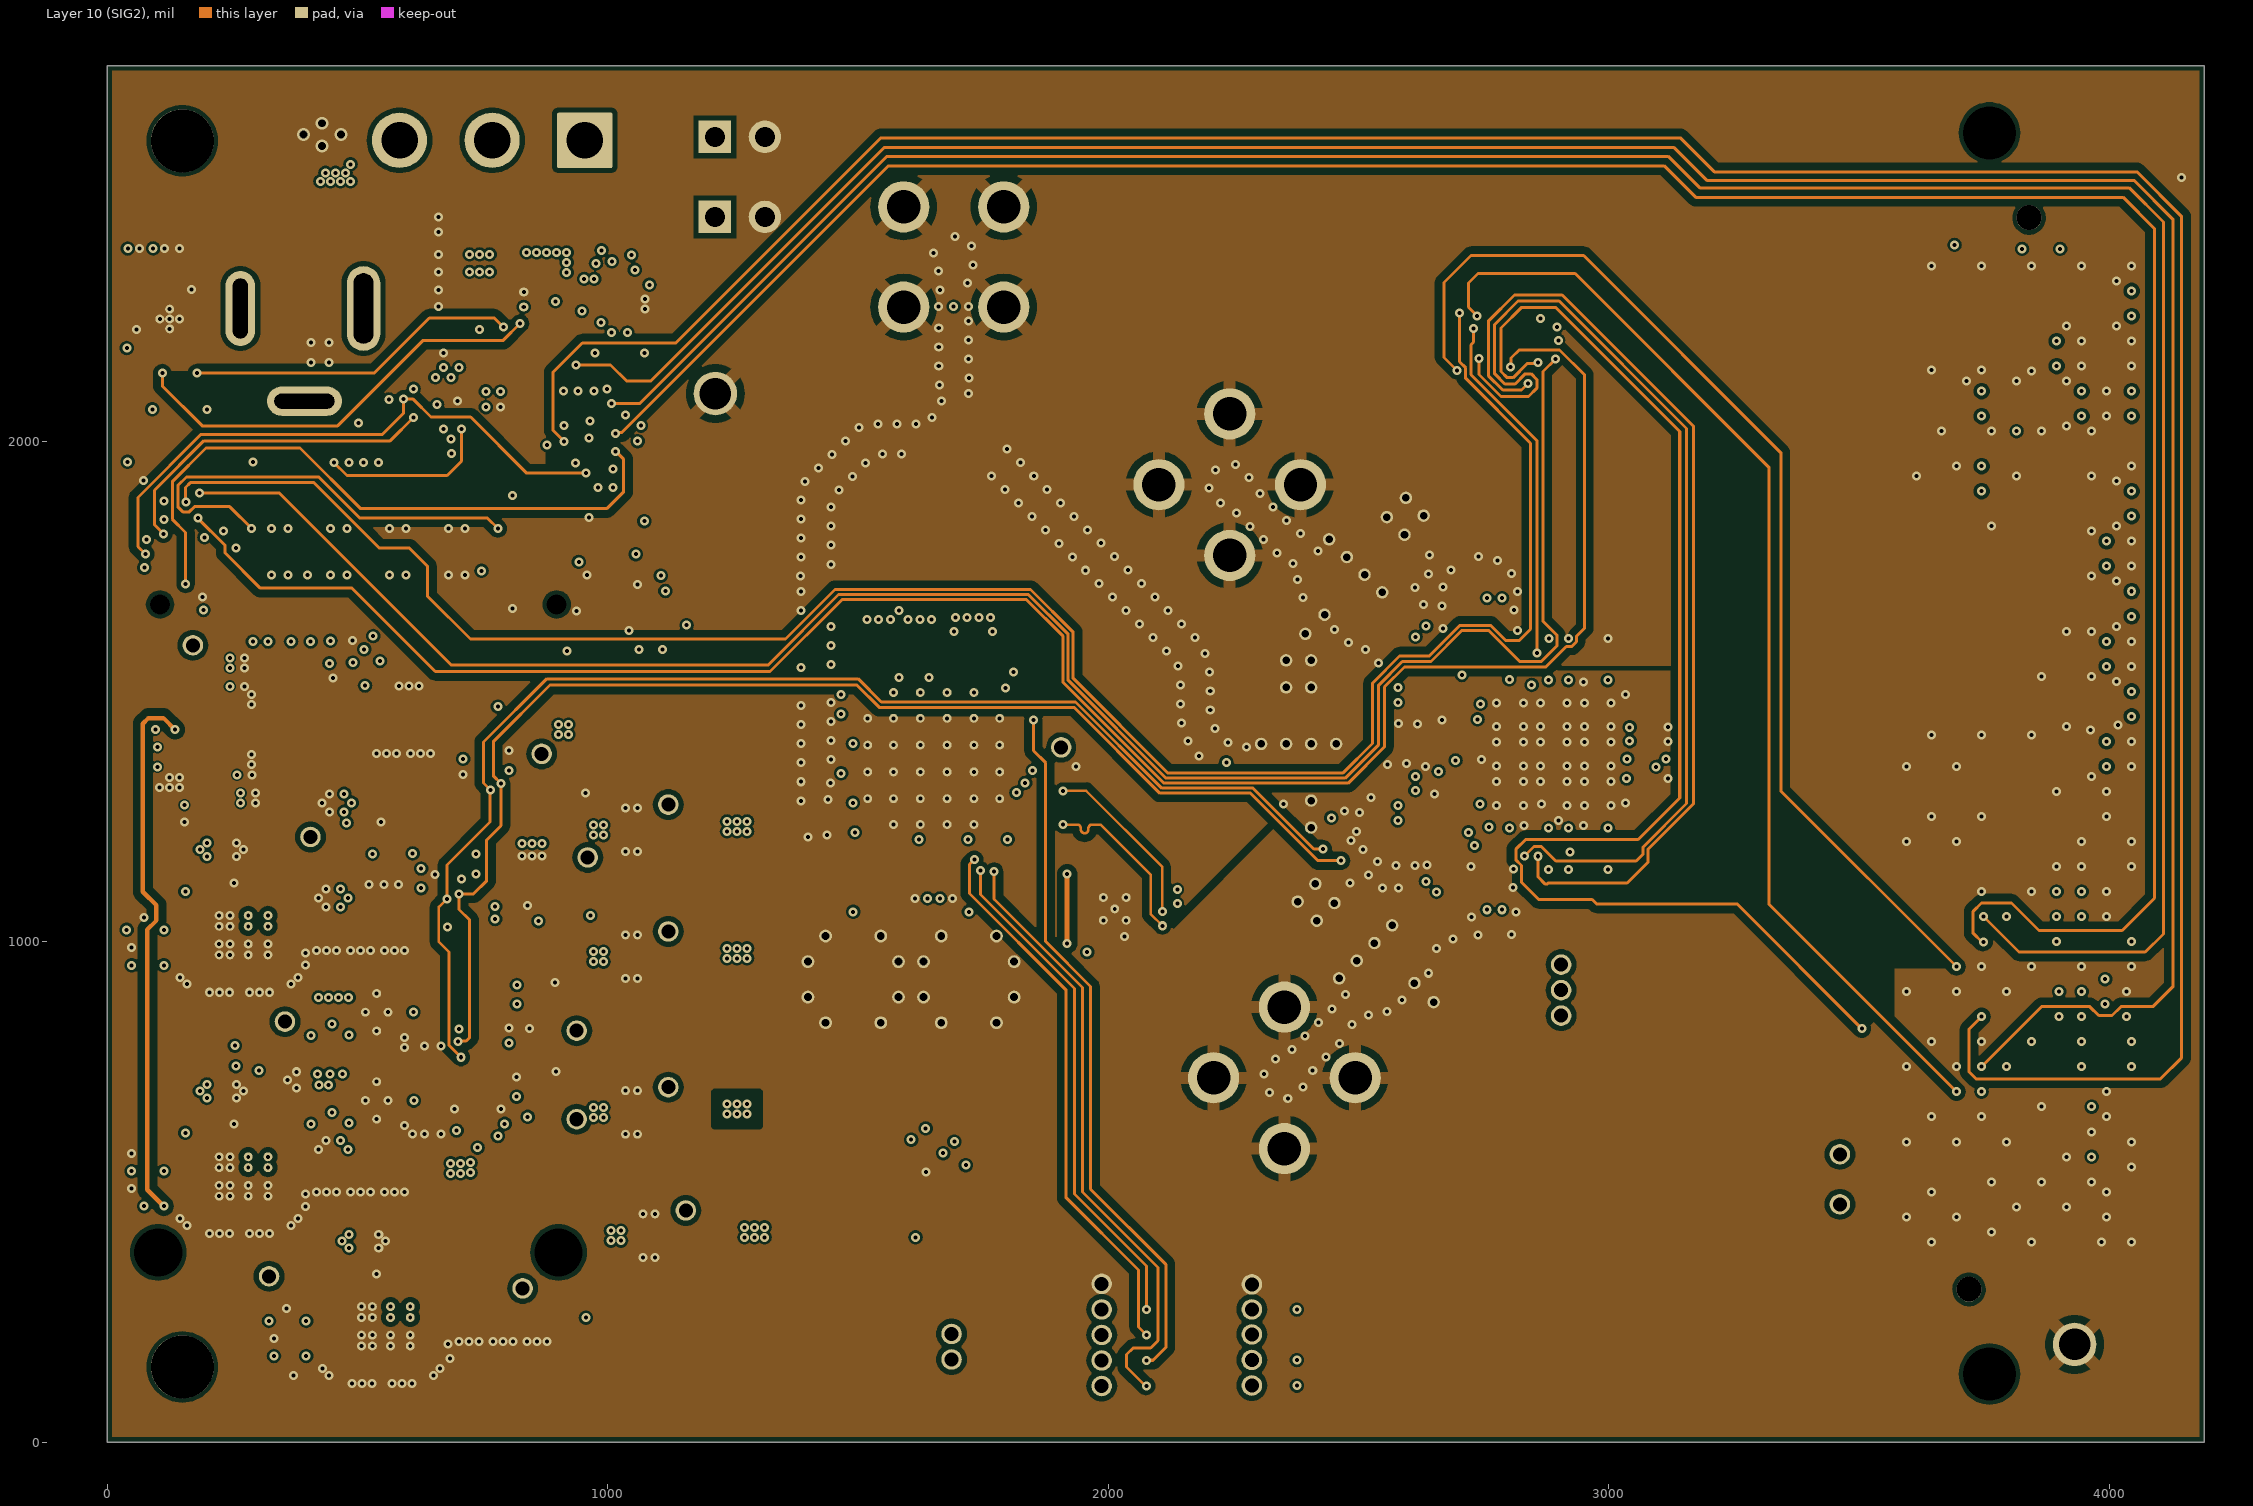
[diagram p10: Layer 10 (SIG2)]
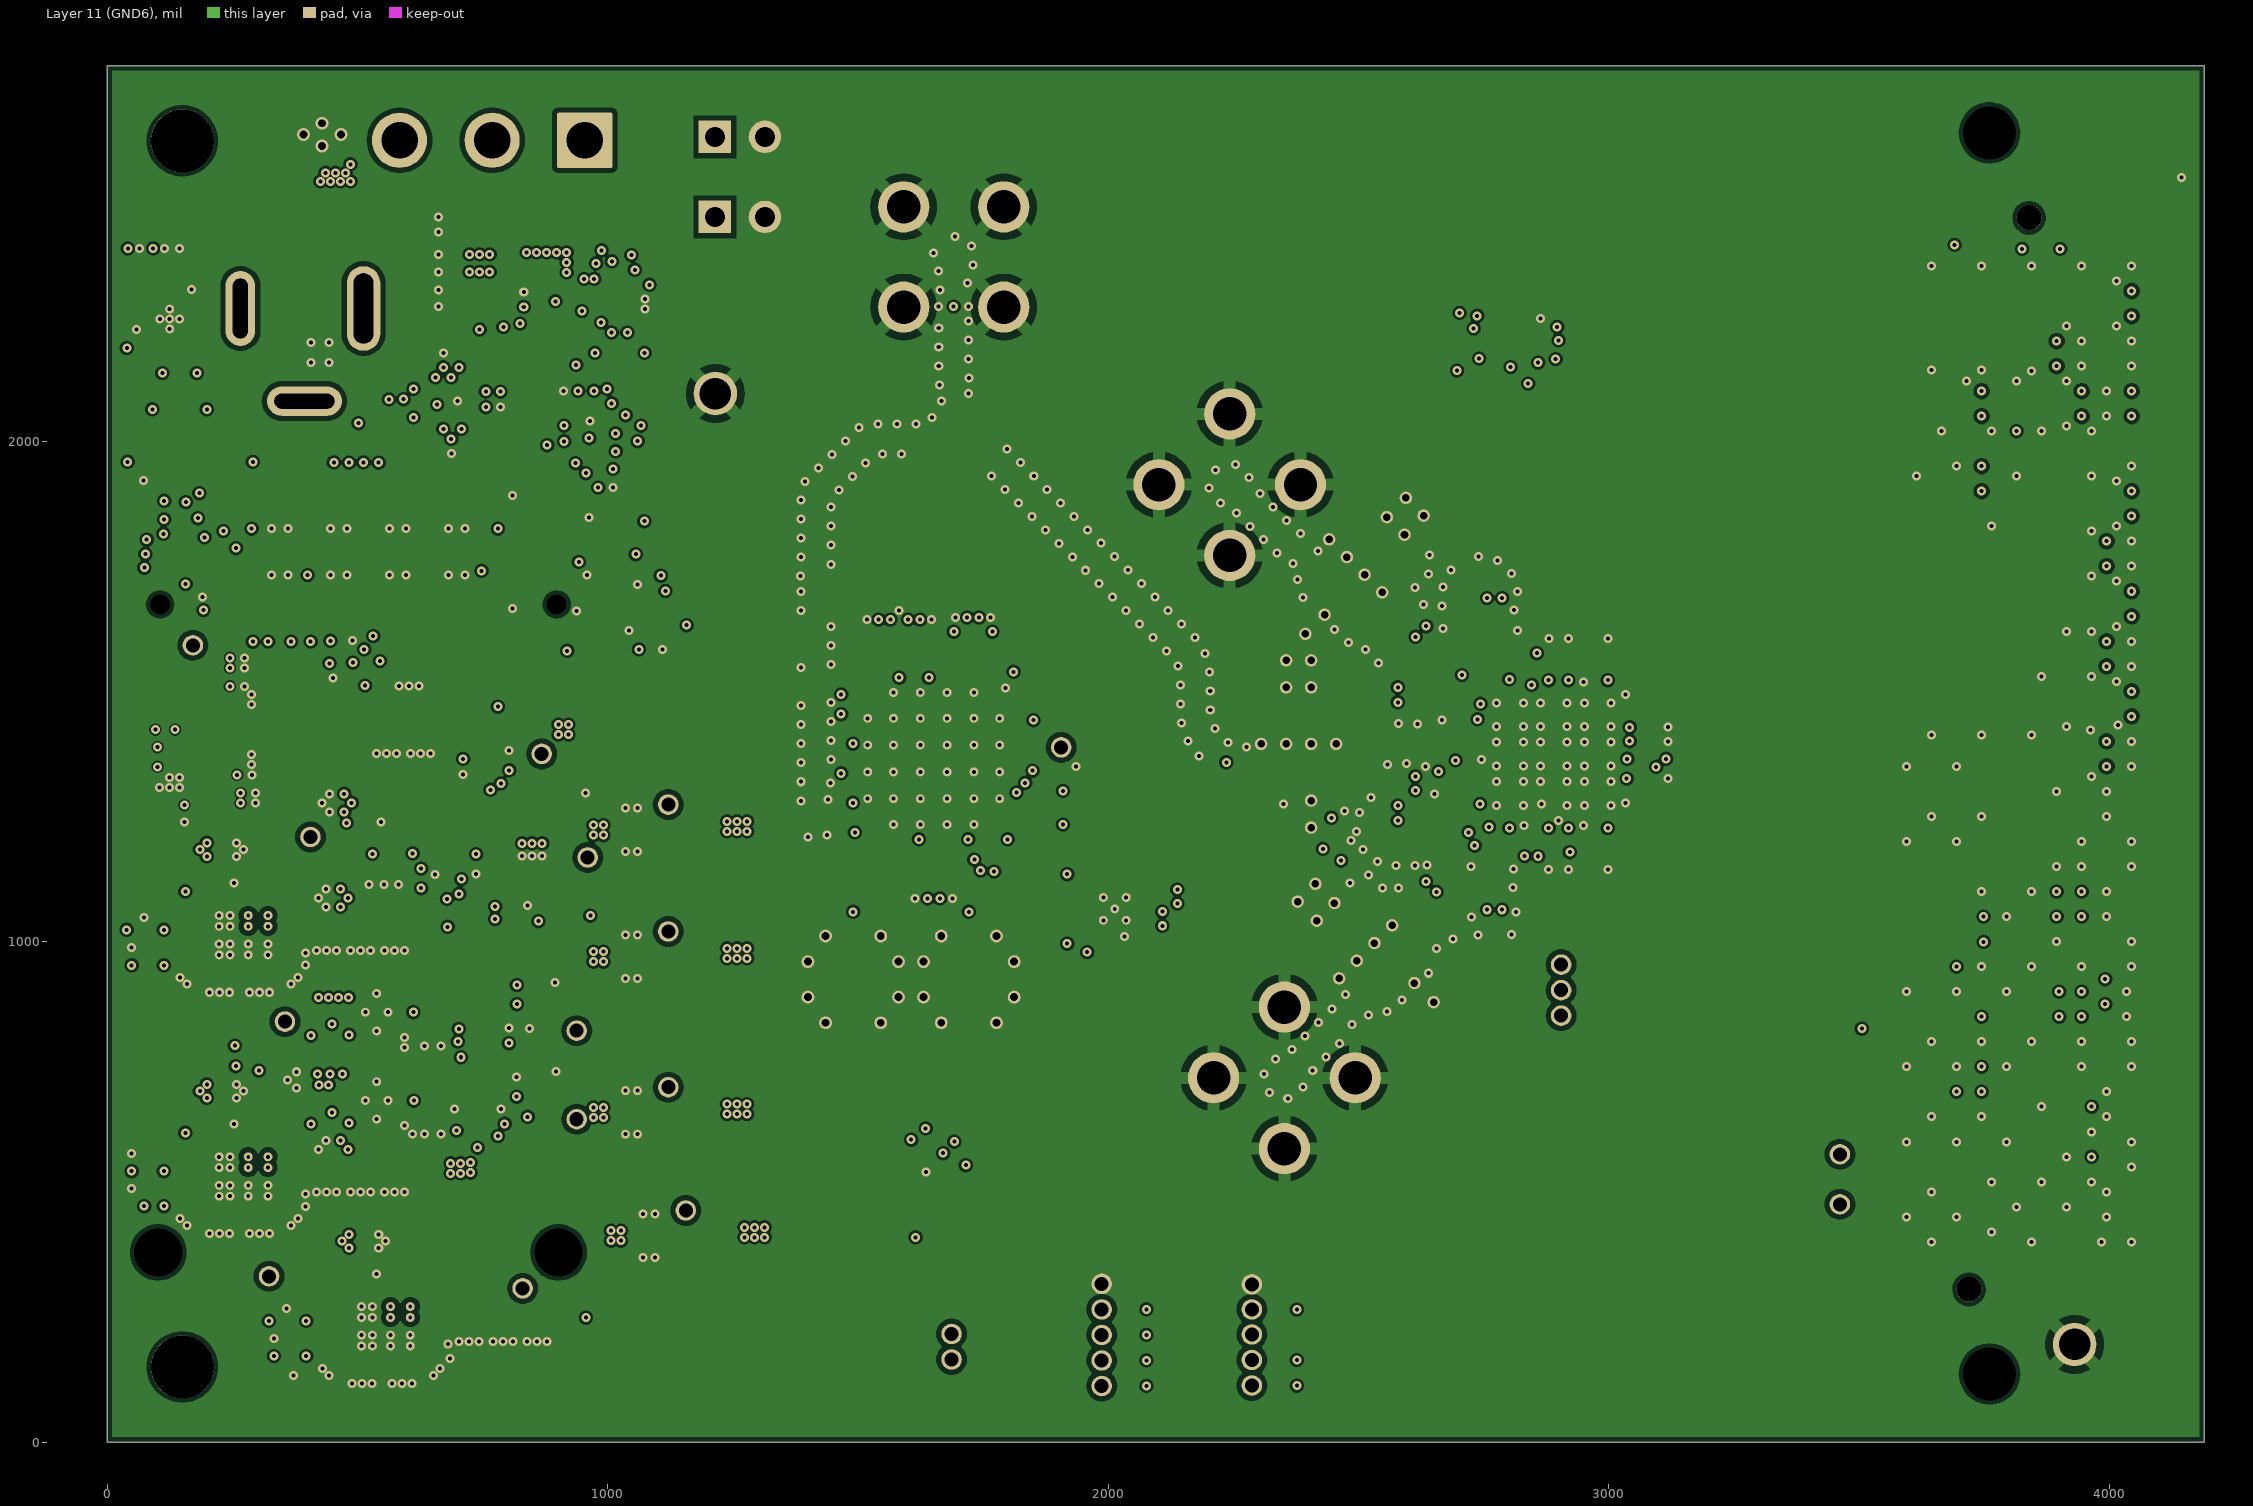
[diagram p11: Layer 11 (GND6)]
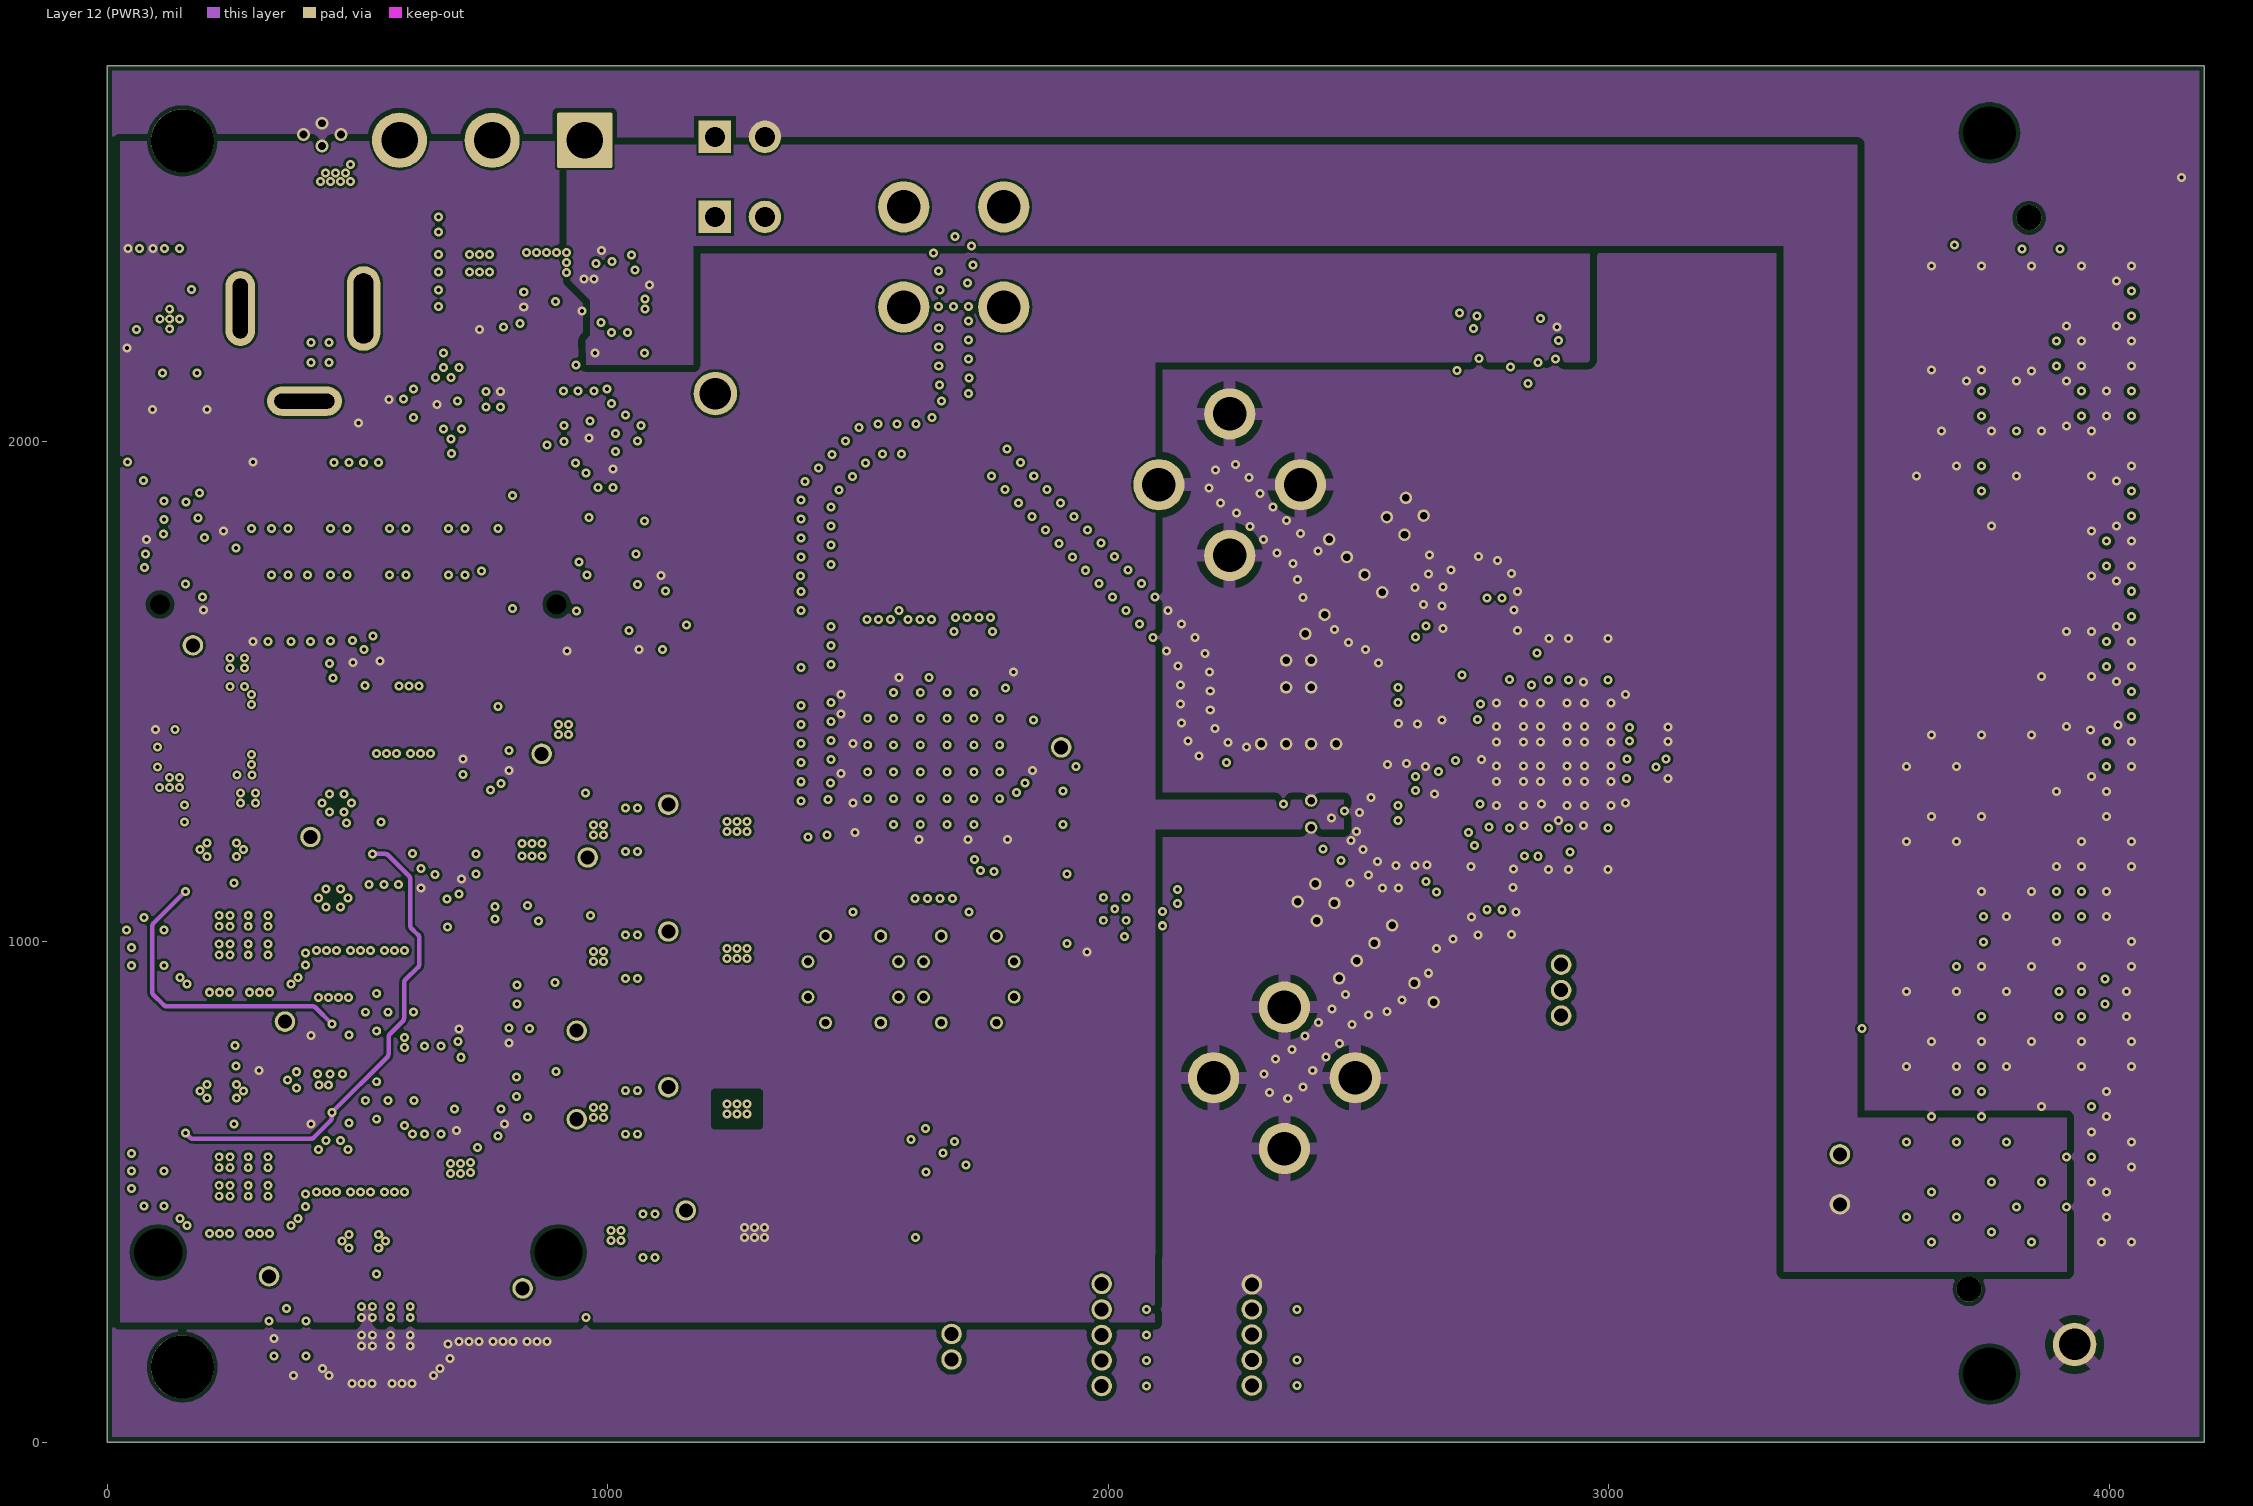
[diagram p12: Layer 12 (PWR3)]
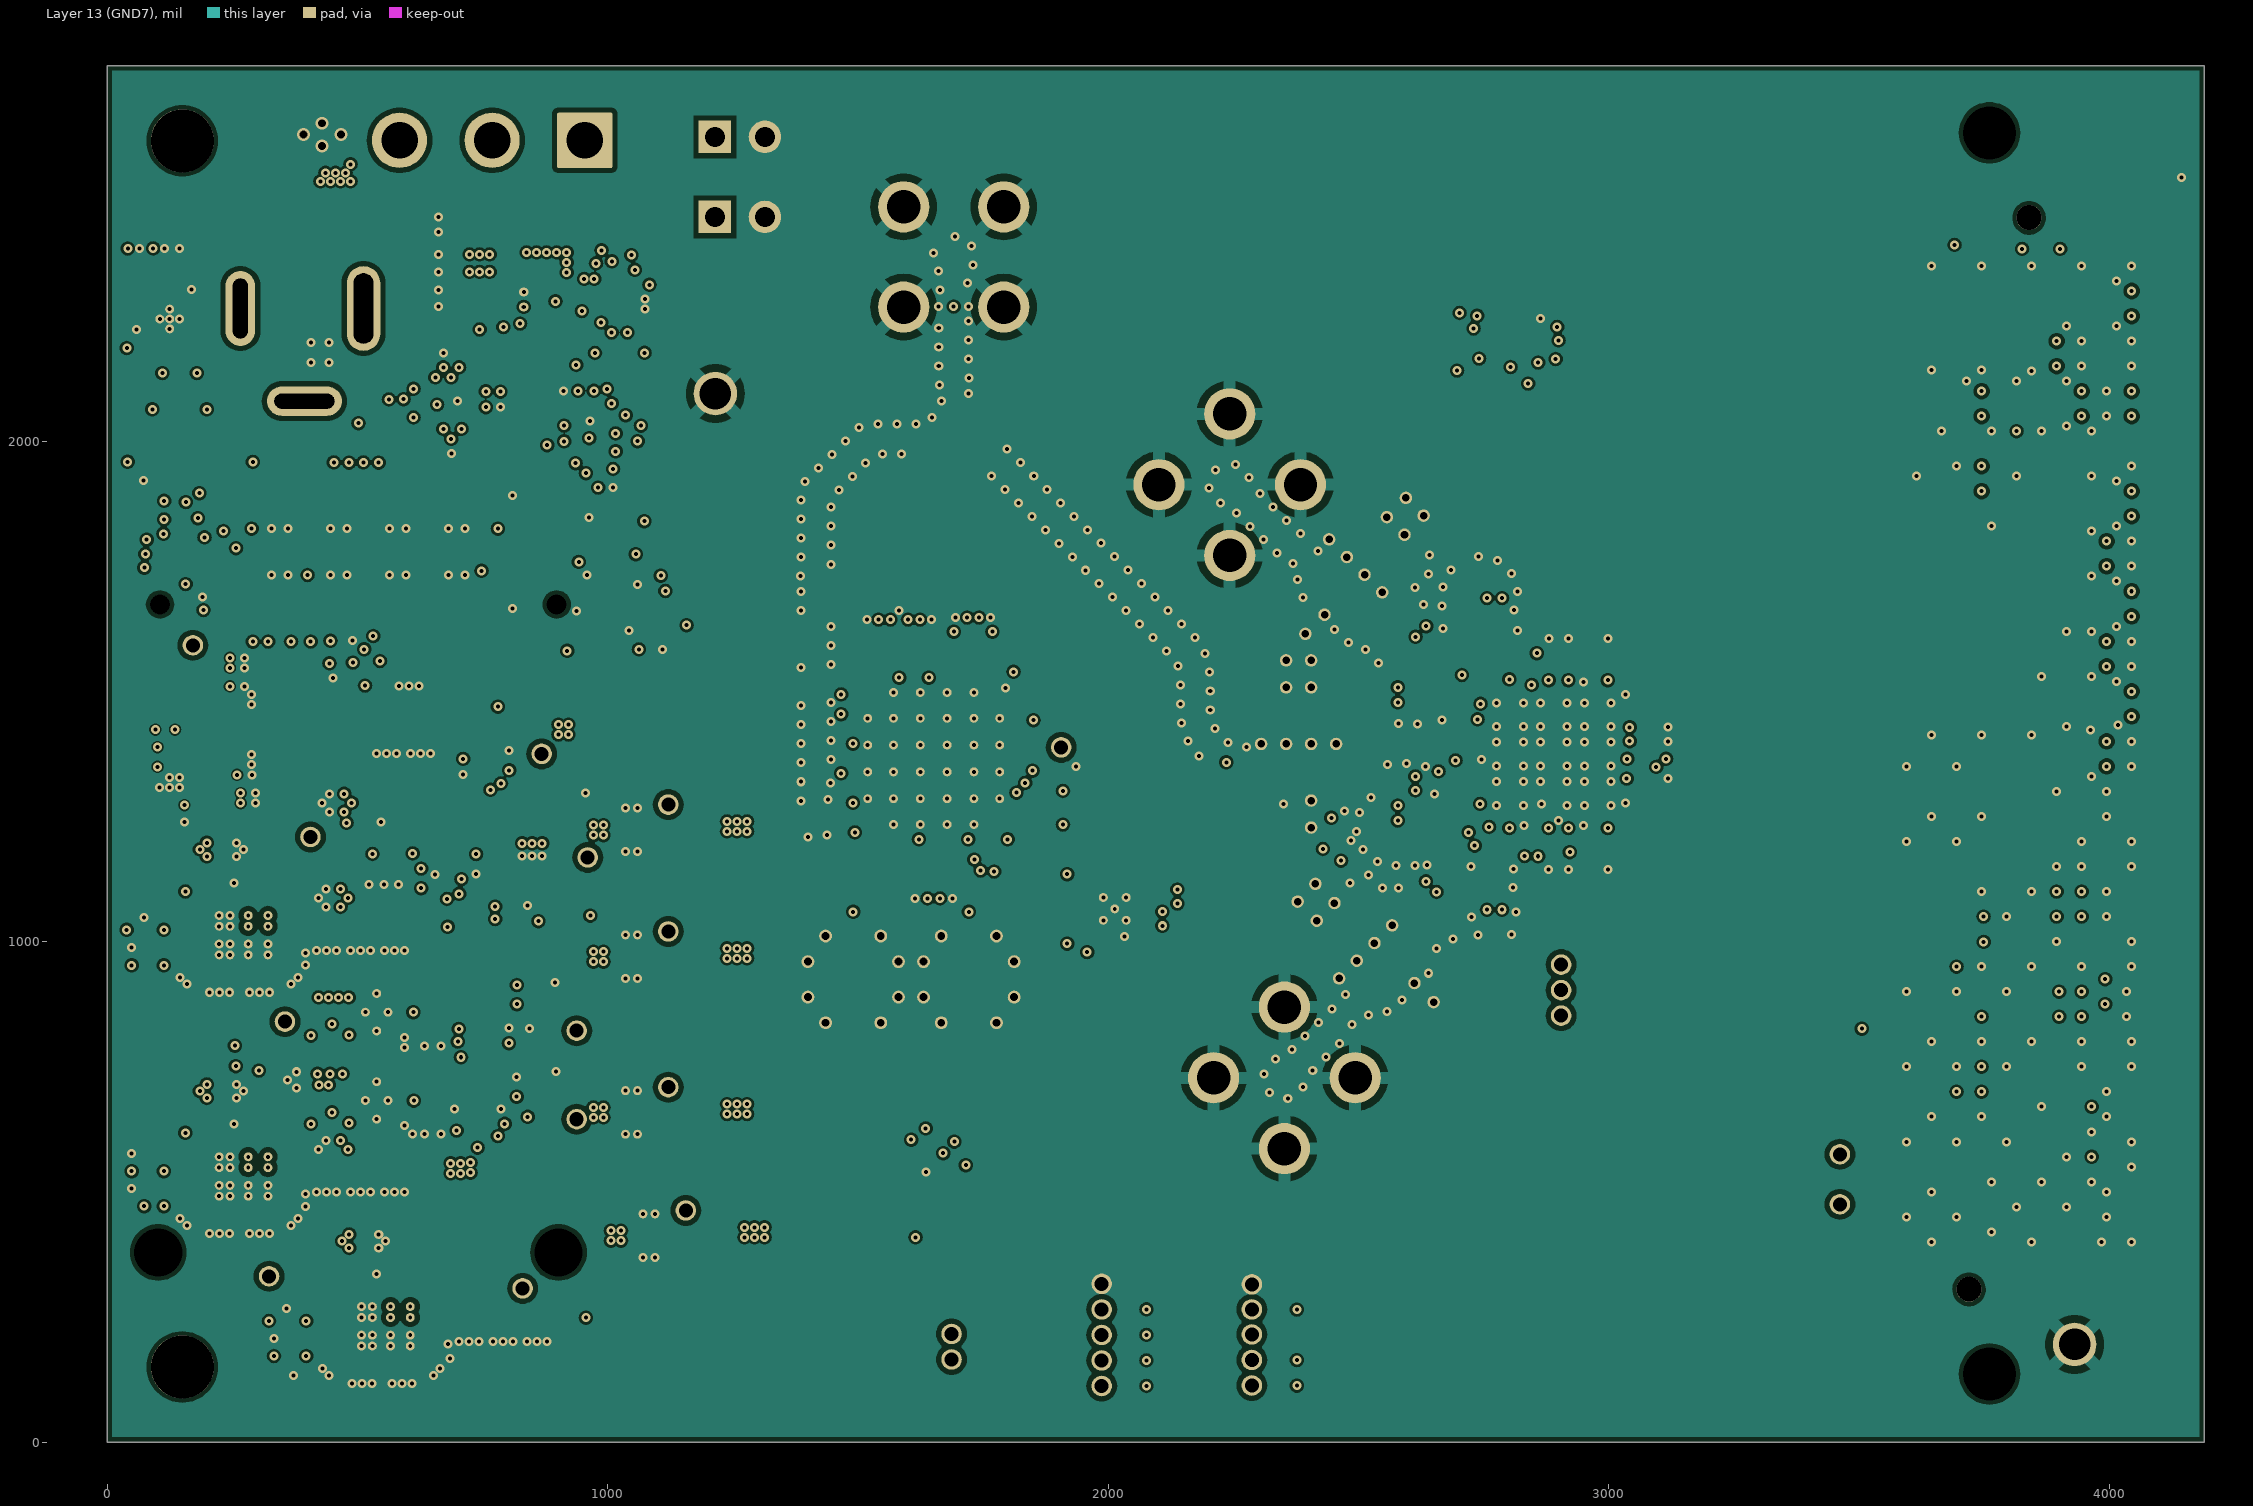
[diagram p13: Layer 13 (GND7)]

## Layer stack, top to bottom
Top Solder Mask: solder mask 0.8, TAIYO-4000-HFX, Dk 3.5
Top Copper: signal copper 1.4
Dielectric 1: core 5.1, Meg4, Dk 3.83
Layer 2 (GND1): signal copper 0.7
Dielectric 2: core 3, FR4-370HR, Dk 3.86
Layer 3 (PWR1): signal copper 1.4
Dielectric 3: prepreg 3, FR4-370HR, Dk 3.72
Layer 4 (GND2: signal copper 0.7
Dielectric 4: core 3, FR4-370HR, Dk 3.86
Layer 5 (PWR2): signal copper 1.4
Dielectric 5: prepreg 3, FR4-370HR, Dk 3.72
Layer 6 (GND3): signal copper 0.7
Dielectric 6: core 3, FR4-370HR, Dk 3.86
Layer 7 (SIG1): signal copper 1.4
Dielectric 7: prepreg 3, FR4-370HR, Dk 3.72
Layer 8 (GND4): signal copper 1.4
Dielectric 8: core 3, FR4-370HR, Dk 3.86
Layer 9 (GND5): signal copper 0.7
Dielectric 9: prepreg 3, FR4-370HR, Dk 3.72
Layer 10 (SIG2): signal copper 1.4
Dielectric 10: core 3, FR4-370HR, Dk 3.86
Layer 11 (GND6): signal copper 0.7
Dielectric 11: prepreg 3, FR4-370HR, Dk 3.72
Layer 12 (PWR3): signal copper 1.4
Dielectric 12: core 3, FR4-370HR, Dk 3.86
Layer 13 (GND7): signal copper 0.7
Dielectric 13: core 5.1, Meg4, Dk 3.83
Bottom Copper: signal copper 1.4
Bottom Solder Mask: solder mask 0.8, TAIYO-4000-HFX, Dk 3.5

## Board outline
0,0 0,2750 4190,2750 4190,0

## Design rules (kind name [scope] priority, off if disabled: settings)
AcuteAngle [All] p1: minimum=4.50000000000000E+0001 checktracksonly=TRUE
AssemblyTestPointUsage [All] p1: valid=2
BoardOutlineClearance BoardOutlineClearance_EDGE_Connectors [HasFootprint('Johnson_142-0761-881_10p5mil_Launch')] p1: gap=25 ignorepadtopadclearanceinfootprint=FALSE except(0: Arc-OutlineEdge Track-OutlineEdge SMDPad-OutlineEdge THPad-OutlineEdge Via-OutlineEdge Fill-OutlineEdge Poly-OutlineEdge Region-OutlineEdge Text-OutlineEdge)
BoardOutlineClearance BoardOutlineClearance_Poly_GND_Layer2 [OnCopper and IsPoly and InNet('GND') and OnLayer('L2 GND1')] p2: gap=25 ignorepadtopadclearanceinfootprint=FALSE except(0: Poly-OutlineEdge)
BoardOutlineClearance BoardOutlineClearance_Poly_GND [OnCopper and IsPoly and InNet('GND')] p3: gap=25 ignorepadtopadclearanceinfootprint=FALSE except(10: Poly-OutlineEdge)
BoardOutlineClearance BoardOutlineClearance_MountingHoles_1 [OnCopper and InComponentClass('Mounting Holes')] p4: gap=39.37 ignorepadtopadclearanceinfootprint=FALSE
BoardOutlineClearance BoardOutlineClearance_Poly [OnCopper and IsPoly] p5: gap=25 ignorepadtopadclearanceinfootprint=FALSE
BoardOutlineClearance [OnCopper and Not InComponentClass('Logo') and not InComponentClass('FiducialMark') and not InRegion(1000,500,4000,800) and not InPoly] p6: gap=25 ignorepadtopadclearanceinfootprint=FALSE
Clearance Clearance_Poly_GND [InPolygon and InNet('GND')] p1: gap=5 ignorepadtopadclearanceinfootprint=TRUE except(8: Arc-Hole Track-Hole SMDPad-Hole THPad-Hole Via-Hole Fill-Hole Poly-Hole Region-Hole Text-Hole; 10: SMDPad-Fill SMDPad-Poly SMDPad-Region THPad-Fill THPad-Poly THPad-Region; 15: Arc-Fill Arc-Poly Arc-Region Track-Fill Track-Poly Track-Region Fill-Fill Fill-Poly Fill-Region Poly-Poly Poly-Region Region-Region)
Clearance Clearance_Keepouts [((IsTrack Or IsArc) And Not InPoly) And IsFree and IsKeepOut vs ((IsTrack Or IsArc) And Not InPoly) And IsFree and IsKeepOut] p2: gap=0 ignorepadtopadclearanceinfootprint=FALSE
Clearance Clearance_Poly [InPolygon] p3: gap=5 ignorepadtopadclearanceinfootprint=TRUE except(8: Arc-Hole Track-Hole SMDPad-Hole THPad-Hole Via-Hole Fill-Hole Poly-Hole Region-Hole Text-Hole; 15: Fill-Fill Fill-Poly Fill-Region Poly-Poly Poly-Region Region-Region)
Clearance Clearance_FiducialMark [IsKeepOut and InComponentClass('FiducialMark') vs IsPad and InComponentClass('FiducialMark')] p4: gap=0 ignorepadtopadclearanceinfootprint=FALSE
Clearance [All vs not InAnyDifferentialPair] p5: gap=5 ignorepadtopadclearanceinfootprint=TRUE except(4: Arc-Arc Arc-Track Arc-SMDPad Arc-THPad Arc-Via Arc-Fill Arc-Poly Arc-Region Arc-Text Track-Track Track-SMDPad Track-THPad Track-Via Track-Fill Track-Poly Track-Region Track-Text; 8: Arc-Hole Track-Hole SMDPad-Hole Fill-Hole Poly-Hole Region-Hole Text-Hole; 10: SMDPad-SMDPad THPad-Fill THPad-Poly THPad-Region THPad-Hole Via-Hole)
ComponentClearance "ComponentClearance Part Overlap" [(InComponent('C105') OR InComponent('C112'))] p1: gap=0 collisioncheckmode=3 verticalgap=0 showdistances=FALSE
ComponentClearance ComponentClearance_ProbePoints_TH [HasFootprint('ProbePoint_TH_40mil')] p2: gap=10 collisioncheckmode=3 verticalgap=0 showdistances=FALSE donotcheckwithout3dbody=TRUE
ComponentClearance ComponentClearance_THtoSMT_NetTieVias [HasFootprint('Net-Tie-Via-8mil') vs IsSMTComponent] p3: gap=0 collisioncheckmode=3 verticalgap=0 showdistances=FALSE donotcheckwithout3dbody=TRUE
ComponentClearance ComponentClearance_MountingHoles_FiducialMarks [InComponentClass('Mounting Holes') vs InComponentClass('FiducialMark')] p4: gap=50 collisioncheckmode=3 verticalgap=10 showdistances=FALSE
ComponentClearance ComponentClearance_Shunt [InComponentClass('Header') vs InComponentClass('Shunt')] p5: gap=0 collisioncheckmode=3 verticalgap=0 showdistances=FALSE
ComponentClearance ComponentClearance_Logo [InComponentClass('Logo')] p6: gap=50 collisioncheckmode=3 verticalgap=10 showdistances=FALSE
ComponentClearance ComponentClearance_ScrewToNut [(HasFootprint('NY PMS 440 0025 PH')) vs (HasFootprint('Keystone_1902C'))] p7: gap=5 collisioncheckmode=3 verticalgap=10 showdistances=FALSE
ComponentClearance ComponentClearance_MountingHoles [InComponentClass('Mounting Holes')] p8: gap=200 collisioncheckmode=3 verticalgap=100000 showdistances=FALSE
ComponentClearance ComponentClearance_SmallPassives [HasFootprint('0201*') or HasFootprint('0402*') or HasFootprint('0508') or HasFootprint('0603*') or HasFootprint('0612') or HasFootprint('0805*') or HasFootprint('0815*') or HasFootprint('0830*') or HasFootprint('1206*') or HasFootprint('1210*') or HasFootprint('1808*') or HasFootprint('1812*') or HasFootprint('1825*') or HasFootprint('2010*') or HasFootprint('2220*') or HasFootprint('2225*') or HasFootprint('2512*') or HasFootprint('2728*') or HasFootprint('3518*') vs HasFootprint('0201*') or HasFootprint('0402*') or HasFootprint('0508') or HasFootprint('0603*') or HasFootprint('0612') or HasFootprint('0805*') or HasFootprint('0815*') or HasFootprint('0830*') or HasFootprint('1206*') or HasFootprint('1210*') or HasFootprint('1808*') or HasFootprint('1812*') or HasFootprint('1825*') or HasFootprint('2010*') or HasFootprint('2220*') or HasFootprint('2225*') or HasFootprint('2512*') or HasFootprint('2728*') or HasFootprint('3518*')] p9: gap=10 collisioncheckmode=3 verticalgap=10 showdistances=FALSE
ComponentClearance ComponentClearance_THtoSMT [IsThruComponent vs IsSMTComponent] p10: gap=20 collisioncheckmode=3 verticalgap=0 showdistances=FALSE
ComponentClearance ComponentClearance_THtoTH [IsThruComponent vs IsThruComponent] p11: gap=30 collisioncheckmode=3 verticalgap=30 showdistances=FALSE
ComponentClearance [All] p12: gap=10 collisioncheckmode=3 verticalgap=10 showdistances=FALSE
DiffPairsRouting [All] p1: maxlimit=15 minlimit=3 mostfreqgap=5 toplayer_minwidth=3 toplayer_maxwidth=15 toplayer_prefwidth=7 midlayer1_prefgap=4 midlayer1_minwidth=3 midlayer1_maxwidth=15 midlayer1_prefwidth=5 midlayer2_prefgap=4 midlayer2_minwidth=3 midlayer2_maxwidth=15 midlayer2_prefwidth=5 midlayer3_prefgap=6 midlayer3_minwidth=3 midlayer3_maxwidth=15 midlayer3_prefwidth=4 midlayer4_prefgap=4 midlayer4_minwidth=3 midlayer4_maxwidth=15 midlayer4_prefwidth=5 midlayer5_prefgap=4 midlayer5_minwidth=3 midlayer5_maxwidth=15 midlayer5_prefwidth=5 midlayer6_prefgap=4 midlayer6_minwidth=3 midlayer6_maxwidth=15 midlayer6_prefwidth=5 midlayer7_prefgap=4 midlayer7_minwidth=3 midlayer7_maxwidth=15 midlayer7_prefwidth=5 midlayer8_prefgap=4 midlayer8_minwidth=3 midlayer8_maxwidth=15 midlayer8_prefwidth=5 midlayer9_prefgap=4 midlayer9_minwidth=3 midlayer9_maxwidth=15 midlayer9_prefwidth=5 midlayer10_prefgap=4 midlayer10_minwidth=3 midlayer10_maxwidth=15 midlayer10_prefwidth=5 midlayer11_prefgap=6 midlayer11_minwidth=3 midlayer11_maxwidth=15 midlayer11_prefwidth=4 midlayer12_minwidth=3 midlayer12_maxwidth=15 midlayer12_prefwidth=4 bottomlayer_minwidth=3 bottomlayer_maxwidth=15 bottomlayer_prefwidth=7 maxuncoupledlength=1000
FabricationTestPointUsage TestPointUsage [All] p1: valid=2 allowmultiple=FALSE
FabricationTestpoint Testpoint [All] p1: side=3 testpointundercomponent=TRUE minsize=40 maxsize=100 preferedsize=60 minholesize=0 maxholesize=40 preferedholesize=32 testpointgrid=1 allowsidetop=TRUE allowsidebottom=TRUE usegrid=TRUE gridtolerance=0.01
FanoutControl Fanout_LCC [IsLCC] p1: bgadir=Out bgaviamode=Centered fanoutstyle=Auto fanoutdirection=Alternating viagrid=1 // Fanout_LCC (Default Rule)
FanoutControl Fanout_BGA [IsBGA] p2: bgadir=Out bgaviamode=Centered fanoutstyle=Auto fanoutdirection=Alternating viagrid=1 // Fanout_BGA (Default Rule)
FanoutControl Fanout_Default [All] p4: bgadir=Out bgaviamode=Centered fanoutstyle=Auto fanoutdirection=Alternating viagrid=1 // Fanout_Default (Default Rule)
FanoutControl Fanout_Small [(CompPinCount < 5)] p5: bgadir=Out bgaviamode=Centered fanoutstyle=Auto fanoutdirection=OutThenIn viagrid=1 // Fanout_Small (Default Rule)
HoleSize [All] p1: absolutevalues=TRUE maxlimit=251 minlimit=7.87 maxpercent=80.000 minpercent=20.000
HoleToHoleClearance HoleToHoleClearance_MarkiBalun [(InComponent('t4') OR InComponent('t5'))] p1: gap=7 allowstackedmicrovias=TRUE
HoleToHoleClearance [All] p2: gap=8 allowstackedmicrovias=TRUE
MatchedLengths "GBT CLK" [InNetClass('GBT CLK')] p1 off: tolerance=10 checknetsindiffpair=FALSE checkdiffpairvsdiffpair=TRUE checkxsignals=TRUE checkothers=TRUE
MinimumAnnularRing MinimumAnnularRing_ThermalPadVias [IsVia and InAnyComponent] p1: minimumring=0
MinimumAnnularRing [All] p2: minimumring=0
MinimumSolderMaskSliver MinimumSolderMaskSliver_Baluns [InComponent('T4')or InComponent('T5')] p1: minsoldermaskwidth=0
MinimumSolderMaskSliver MinimumSolderMaskSliver_Logo [InComponentClass('Logo') vs InComponentClass('Logo')] p2: minsoldermaskwidth=0.7
MinimumSolderMaskSliver [All] p3: minsoldermaskwidth=3
NetAntennae [Not((InNetClass('PWR1') or InNetClass('PWR2') or InNetClass('PWR3') or InNetClass('PWR4')) and ViaDiameter = 20)] p1: netantennaetolerance=0
PlaneConnect [All] p1: planeconnectstyle=Relief reliefexpansion=10 reliefentries=4 reliefconductorwidth=10 reliefairgap=10
PolygonConnect PolygonConnect_1 [All vs IsNamedPolygon('12V_PLUG_L10_P2314')] p1: connectstyle=Direct reliefconductorwidth=10 reliefentries=4 polygonreliefangle="90 Angle" airgapwidth=10
PolygonConnect "Thermal Pads" [IsPolygon vs IsPad and HoleSize <= 41] p2: connectstyle=Direct reliefconductorwidth=10 reliefentries=4 polygonreliefangle="90 Angle" airgapwidth=10
PolygonConnect "Thermal Pads Edge SMA" [IsPolygon and OnLayer('L2 GND1') vs IsPad and HoleSize = 45] p3: connectstyle=Direct reliefconductorwidth=10 reliefentries=4 polygonreliefangle="90 Angle" airgapwidth=10
PolygonConnect [All] p4: thpad.connectstyle=Relief thpad.reliefconductorwidth=25 thpad.reliefentries=4 thpad.polygonreliefangle="45 Angle" thpad.airgapwidth=15 smdpad.connectstyle=Direct smdpad.reliefconductorwidth=10 smdpad.reliefentries=4 smdpad.polygonreliefangle="90 Angle" smdpad.airgapwidth=10 via.connectstyle=Direct via.reliefconductorwidth=10 via.reliefentries=4 via.polygonreliefangle="90 Angle" via.airgapwidth=10
RoutingVias ThermalPadVias [IsVia and InAnyComponent] p1: holewidth=7.87 width=19.68 viastyle="Through Hole" minholewidth=6 minwidth=16 maxholewidth=65 maxwidth=65
RoutingVias [All] p2: holewidth=16 width=34 viastyle="Through Hole" minholewidth=6 minwidth=16 maxholewidth=40 maxwidth=65
SilkToBoardRegionClearance [Not ((IsComment or IsDesignator) And (Hide <> 'False')) and not InRegion(1000,500,4000,800)] p1:
SilkToSilkClearance SilkToSilkClearance_Pb-FreeLogo [(HasFootprint('Pb-Free_Overlay_Medium') OR HasFootprint('Pb-Free_Overlay_Small')) vs (HasFootprint('Pb-Free_Overlay_Medium') OR HasFootprint('Pb-Free_Overlay_Small'))] p1: silktosilkclearance=0
SilkToSilkClearance [All] p2: silktosilkclearance=0
SilkToSolderMaskClearance SilkToComponentPadClearance [(IsPad or IsFill or IsRegion) and InAnycomponent] p1: minsilkscreentomaskgap=0 clearancetoexposedcopper=TRUE
SilkToSolderMaskClearance "Silk to Solder Mask Opening" [All] p2: minsilkscreentomaskgap=0 clearancetoexposedcopper=FALSE
SolderMaskExpansion [All] p1: expansion=1.97 istentingtop=FALSE
UnRoutedNet [All] p1: checkbadconnections=TRUE
Width [All] p1: maxlimit=100 minlimit=4 preferedwidth=5 toplayer_prefwidth=10 bottomlayer_prefwidth=10 minimp=50.000000 maximp=50.000000 favimp=50.000000 checkconnectedcopper=TRUE
12 further rules are at their usual default settings.

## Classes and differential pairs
net class "Clock Power Divider": CLK_LMK NetC101_1 NetC103_2 NetR132_1
net class "FPGA MGT REFCLK": FPGA_GBTCLK0_FMC_N FPGA_GBTCLK0_FMC_P FPGA_GBTCLK1_FMC_N FPGA_GBTCLK1_FMC_P
net class "FPGA CORECLK": FPGA_CORECLK_N FPGA_CORECLK_P
net class "GBT CLK": FPGA_GBTCLK0_FMC_N FPGA_GBTCLK0_FMC_P FPGA_GBTCLK1_FMC_N FPGA_GBTCLK1_FMC_P
net class SERDES_DP: ADC_SYSREF_N ADC_SYSREF_P DOUT0_ADC_N DOUT0_ADC_P DOUT0_FMC_N DOUT0_FMC_P DOUT1_ADC_N DOUT1_ADC_P DOUT1_FMC_N DOUT1_FMC_P DOUT2_ADC_N DOUT2_ADC_P DOUT2_FMC_N DOUT2_FMC_P DOUT3_ADC_N DOUT3_ADC_P DOUT3_FMC_N DOUT3_FMC_P DOUT4_ADC_N DOUT4_ADC_P DOUT4_FMC_N DOUT4_FMC_P DOUT5_ADC_N DOUT5_ADC_P DOUT5_FMC_N DOUT5_FMC_P DOUT6_ADC_N DOUT6_ADC_P DOUT6_FMC_N DOUT6_FMC_P DOUT7_ADC_N DOUT7_ADC_P DOUT7_FMC_N DOUT7_FMC_P FPGA_CORECLK_N FPGA_CORECLK_P FPGA_GBTCLK0_FMC_N FPGA_GBTCLK0_FMC_P FPGA_GBTCLK1_FMC_N FPGA_GBTCLK1_FMC_P FPGA_SYSREF_N FPGA_SYSREF_P SYSREF_ADC_N SYSREF_ADC_P SYSREF_FPGA_N SYSREF_FPGA_P SYSREF_LMK_ADC_N SYSREF_LMK_ADC_P SYSREF_LMK_FPGA_N SYSREF_LMK_FPGA_P
net class Power: 3p3V_Utility 12V 12V_FMC 12V_Plug 12V_VIN+ AVDD12 AVDD18 CLKVDD VDDL18
component class DC142D_ADC32RF55_MUX_RevA1: J7 J8 PP14 PP15 PP16 PP17 PP18 PP19 PP20 PP21 PP22 PP23 PP24 PP25 PP26 PP27 r R40 R41 R42 R43 R44 R45 R46 R47 R48 R49 R50 R51 R52 R53 R54 R56 R57 R58 R59 R60 R61 R62 R63 R64 R65 R66 R68 R69 R73 R75 R77 R81 R83 SH-J7 SH-J8 U16 U17 U18 U19 U20 U32
component class DC142D_ADC32RF55_Power3_RevA1: C25 C28 C29 C33 C40 C41 C42 C43 C46 C51 C52 C53 C54 C55 C56 C57 C59 C60 C64 C65 C164 C165 C166 C177 C178 FB5 FB6 FC6 L7 PP9 PP10 PP11 PP12 PP13 r R26 R27 R30 R31 R32 R34 R35 R36 R37 R38 R39 R76 R78 R100 R155 R181 R182 U10 U12 U13 U14 U15 U31
component class DC142D_ADC32RF55_ADC_Dig_RevA1: C44 C84 C85 C86 C87 C88 C89 C90 C91 C92 C93 C94 C95 C96 C97 C98 C100 C101 C102 C103 C104 C106 C153 J4 R13 R24 R25 R28 R29 R74 R132 R133 R134 R135 SW3 T3 U1 U11 U27
component class DC142D_ADC32RF55_USB_RevA1: C67 J3 PP28 R55 R79 R80 R82 R84 R85 R88 R90 R91 R92 R93 R94 R95 R96 R97 R177 U21 U22 U23 U25 U26
component class DC142D_ADC32RF55_Misc_RevA1: FID1 FID2 FID3 H5 H6 H7 H8 H9 H10 LBL1 Logo1 LOGO2 Logo3 Logo4 ZZ1 ZZ2 ZZ3 ZZ4
component class DC142D_ADC32RF55_ADC_Input_RevA1: C68 C69 C70 C71 C72 C73 C74 C75 C76 C77 C78 C79 C80 C81 C82 C83 C99 C154 C155 C156 C157 C158 J5 J6 R99 R101 R102 R103 R104 R105 R106 R107 R108 R109 R110 R111 R112 R113 R114 R115 R116 R117 R118 R119 R120 R121 R122 R123 R124 R125 R126 R130 R131 R164 T1 T2
component class DC142D_ADC32RF55_ADC_Power_RevA1: C109 C110 C111 C112 C113 C114 C115 C116 C117 C118 C119 C120 C121 C122 C123 C124 C125 C126 C127 C128 C129 C130 C131 C132 C160 U29
component class DC142D_ADC32RF55_FMC_RevA1: J1 PP29 PP30 R67 R70 R71 R72 R140
component class DC142D_ADC32RF55_LMK_RevA1: C45 C50 C105 C107 C108 C133 C134 C135 C136 C137 C138 C139 C140 C141 C142 C143 C144 C145 C146 C147 C148 C149 C150 C151 C152 J9 J10 PP31 R127 R128 R129 R141 R142 R143 R144 R145 R146 R147 R148 R149 R150 R151 R152 R153 R154 R157 R158 R159 R160 R161 R162 R163 U2 U28
component class DC142D_ADC32RF55_Power2_RevA1: C13 C14 C16 C17 C18 C19 C20 C21 C22 C23 C24 C26 C27 C30 C31 C32 C34 C35 C39 C159 FB2 FB3 FB4 FC3 FC4 PP4 PP5 PP6 PP7 PP8 R11 R12 R14 R15 R16 R17 R18 R19 R20 R21 R22 R23 R33 U5 U6 U7 U8 U9 U33
component class DC142D_ADC32RF55_Power1_RevA1: C1 C2 C3 C4 C5 C6 C7 C8 C9 C10 C11 C12 C15 D1 D2 D3 FB1 FC1 J2 PP1 PP2 PP3 Q1 R1 R2 R3 R4 R5 R6 R7 R8 R9 R10 SW1 TP3 TP4 U3 U4 U30
differential pair SYSREF_LMK_FPGA: +SYSREF_LMK_FPGA_P -SYSREF_LMK_FPGA_N
differential pair SYSREF_LMK_ADC: +SYSREF_LMK_ADC_P -SYSREF_LMK_ADC_N
differential pair SYSREF_FPGA: +SYSREF_FPGA_P -SYSREF_FPGA_N
differential pair SYSREF_ADC: +SYSREF_ADC_P -SYSREF_ADC_N
differential pair FPGA_SYSREF: +FPGA_SYSREF_P -FPGA_SYSREF_N
differential pair FPGA_GBTCLK1_FMC: +FPGA_GBTCLK1_FMC_P -FPGA_GBTCLK1_FMC_N
differential pair FPGA_GBTCLK0_FMC: +FPGA_GBTCLK0_FMC_P -FPGA_GBTCLK0_FMC_N
differential pair FPGA_CORECLK: +FPGA_CORECLK_P -FPGA_CORECLK_N
differential pair ADC_SYSREF: +ADC_SYSREF_P -ADC_SYSREF_N
differential pair SYSREFIN: +SYSREFIN_P -SYSREFIN_N
differential pair IND_ADC: +INB2_ADC_P -INB2_ADC_N
differential pair INC_ADC: +INB1_ADC_P -INB1_ADC_N
differential pair INB_ADC: +INA2_ADC_P -INA2_ADC_N
differential pair INA_ADC: +INA1_ADC_P -INA1_ADC_N
differential pair DOUT7_FMC: +DOUT7_FMC_P -DOUT7_FMC_N
differential pair DOUT7_ADC: +DOUT7_ADC_P -DOUT7_ADC_N
differential pair DOUT6_FMC: +DOUT6_FMC_P -DOUT6_FMC_N
differential pair DOUT6_ADC: +DOUT6_ADC_P -DOUT6_ADC_N
differential pair DOUT5_FMC: +DOUT5_FMC_P -DOUT5_FMC_N
differential pair DOUT5_ADC: +DOUT5_ADC_P -DOUT5_ADC_N
differential pair DOUT4_FMC: +DOUT4_FMC_P -DOUT4_FMC_N
differential pair DOUT4_ADC: +DOUT4_ADC_P -DOUT4_ADC_N
differential pair DOUT3_FMC: +DOUT3_FMC_P -DOUT3_FMC_N
differential pair DOUT3_ADC: +DOUT3_ADC_P -DOUT3_ADC_N
differential pair DOUT2_FMC: +DOUT2_FMC_P -DOUT2_FMC_N
differential pair DOUT2_ADC: +DOUT2_ADC_P -DOUT2_ADC_N
differential pair DOUT1_FMC: +DOUT1_FMC_P -DOUT1_FMC_N
differential pair DOUT1_ADC: +DOUT1_ADC_P -DOUT1_ADC_N
differential pair DOUT0_FMC: +DOUT0_FMC_P -DOUT0_FMC_N
differential pair DOUT0_ADC: +DOUT0_ADC_P -DOUT0_ADC_N
differential pair CLK_ADC: +CLK_ADC_P -CLK_ADC_N

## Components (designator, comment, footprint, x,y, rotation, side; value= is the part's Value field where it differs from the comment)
C1 "04023C104JAT2A" 0402L_cap 832.43,2291.03 r270 bottom value="0.1 uF"
C2 "C2012X7R1H105K125AB" 0805L_cap 382.01,2294.97 r180 bottom value="1 uF"
C3 "C2012X7R1H105K125AB" 0805L_cap 700.47,2287 r180 bottom value="1 uF"
C4 "C2012X7R1H105K125AB" 0805L_cap 700.47,2355 r180 bottom value="1 uF"
C5 "02013C102KAT2A" 0201_cap 341.66,2672.2 r0 bottom value="0.001 uF"
C6 "02013C102KAT2A" 0201_cap 341.66,2649 r0 bottom value="0.001 uF"
C7 "C2012X7S1E106K125AC" 0805L_cap 512.91,401.95 r180 top value="10 uF"
C8 "04025C222JAT2A" 0402L_cap 512.91,355.45 r180 top value="2200 pF"
C9 "C2012X7S1A226M125AC" 0805L_cap 722.74,213.56 r90 top value="22 uF"
C10 "C2012X7S1A226M125AC" 0805L_cap 789.84,213.56 r90 top value="22 uF"
C11 "C2012X7S1A226M125AC" 0805L_cap 856.94,213.56 r90 top value="22 uF"
C12 "C2012X7S1A226M125AC" 0805L_cap 1006.42,223.15 r90 top value="22 uF"
C13 "C2012X7S1A226M125AC" 0805L_cap 403.09,723.61 r0 top value="22 uF"
C14 "C2012X7S1A226M125AC" 0805L_cap 458.8,1277.12 r0 top value="22 uF"
C15 "CGA2B1X7S1C474K050BC" 0402L_cap 377.81,276.91 r0 top value="0.47 uF"
C16 "C2012X7S1A226M125AC" 0805L_cap 849,1183.47 r90 top value="22 uF"
C17 "C2012X7S1A226M125AC" 0805L_cap 860.53,1275.43 r0 top value="22 uF"
C18 "04023C104JAT2A" 0402L_cap 755.79,640.01 r0 bottom value="0.1 uF"
C19 "C2012X7S1E106K125AC" 0805L_cap 228.48,701.21 r180 top value="10 uF"
C20 "04025C222JAT2A" 0402L_cap 228.48,654.81 r180 top value="2200 pF"
C21 "C2012X7S1A226M125AC" 0805L_cap 438.31,512.91 r90 top value="22 uF"
C22 "C2012X7S1A226M125AC" 0805L_cap 506.31,512.91 r90 top value="22 uF"
C23 "C2012X7S1A226M125AC" 0805L_cap 574.31,512.91 r90 top value="22 uF"
C24 "C2012X7S1A226M125AC" 0805L_cap 451.57,584.92 r0 bottom value="22 uF"
C25 "C2012X7S1A226M125AC" 0805L_cap 441,933.53 r270 bottom value="22 uF"
C26 "0402ZD106MAT2A" 0402L_cap 818.01,709.66 r270 top value="10 uF"
C27 "C1005X5R1V105K050BE" 0402L_cap 916.76,740.62 r0 top value="1 uF"
C28 "0402ZD106MAT2A" 0402L_cap 775,1025.31 r90 bottom value="10 uF"
C29 "C1005X6S1C225K050BC" 0402L_cap 163.83,1307.74 r0 top value="2.2 uF"
C30 "C1005X6S1C225K050BC" 0402L_cap 93.38,576.26 r0 top value="2.2 uF"
C31 "C1005X5R1A475K050BE" 0402L_cap 667.03,636.15 r90 top value="4.7 uF"
C32 "04023C104JAT2A" 0402L_cap 721.54,1128.42 r180 bottom value="0.1 uF"
C33 "C1005X6S1C225K050BC" 0402L_cap 93.38,1058.45 r0 top value="2.2 uF"
C34 "04025C103MAT2A" 0402L_cap 765.94,1194.5 r90 top value="0.01 uF"
C35 "C1005X5R1V105K050BE" 0402L_cap 956.04,1276.83 r270 top value="1 uF"
C39 "C1005X5R1V105K050BE" 0402L_cap 458.67,1151.26 r0 top value="1 uF"
C40 "04023C104JAT2A" 0402L_cap 803.14,1361.99 r270 bottom value="0.1 uF"
C41 "C2012X7S1A226M125AC" 0805L_cap 558,1389 r90 top value="22 uF"
C42 "C2012X7S1A226M125AC" 0805L_cap 625.97,1389.04 r90 top value="22 uF"
C43 "C2012X7S1A226M125AC" 0805L_cap 603,1497.53 r270 top value="22 uF"
C44 "C0603X5R1E104K030BB" 0201_cap 1614.89,507.52 r270 bottom value="0.1 uF"
C45 "C0603X5R1E104K030BB" 0201_cap 1969,979 r180 bottom value="0.1 uF"
C46 "C2012X7S1A226M125AC" 0805L_cap 780.5,1499 r270 top value="22 uF"
C50 "C0603X5R1E104K030BB" 0201_cap 1928.98,1157.73 r180 bottom value="0.1 uF"
C51 "04023C104JAT2A" 0402L_cap 802.61,810.97 r270 bottom value="0.1 uF"
C52 "C2012X7S1E106K125AC" 0805L_cap 228.48,1184 r180 top value="10 uF"
C53 "04025C222JAT2A" 0402L_cap 228.48,1137 r180 top value="2200 pF"
C54 "C2012X7S1A226M125AC" 0805L_cap 438.32,995.11 r90 top value="22 uF"
C55 "C2012X7S1A226M125AC" 0805L_cap 506.32,995.11 r90 top value="22 uF"
C56 "C2012X7S1A226M125AC" 0805L_cap 574.32,995.11 r90 top value="22 uF"
C57 "C2012X7S1A226M125AC" 0805L_cap 451.58,1087.11 r0 bottom value="22 uF"
C59 "0402ZD106MAT2A" 0402L_cap 843.83,845.65 r90 top value="10 uF"
C60 "C1005X5R1V105K050BE" 0402L_cap 914.76,917.87 r0 top value="1 uF"
C64 "C1005X5R1A475K050BE" 0402L_cap 667.03,812.41 r90 top value="4.7 uF"
C65 "0402ZD106MAT2A" 0402L_cap 965.12,1071.56 r270 bottom value="10 uF"
C67 "C0603X5R1E104K030BB" 0201_cap 58.2,2197 r270 bottom value="0.1 uF"
C68 "GRM0335C1E680FA01D" 0201_cap 2756.89,1609.25 r270 top value="68 pF"
C69 "0201BB104KW160" 0201_cap 2374.29,1781.47 r315 top value="0.1 uF"
C70 "0201BB104KW160" 0201_cap 2584.25,1638.83 r315 top value="0.1 uF"
C71 "C0603X5R1E104K030BB" 0201_cap 2771.9,1651.33 r90 bottom value="0.1 uF"
C72 "GJM0335C1HR60WB01D" 0201_cap 2771.89,1642.32 r180 top value="0.6 pF"
C73 "0201BB104KW160" 0201_cap 2605.46,1660.04 r315 top value="0.1 uF"
C74 "GRM0335C1E680FA01D" 0201_cap 2786.89,1609.25 r270 top value="68 pF"
C75 "GRM0335C1E680FA01D" 0201_cap 2655.75,1508.11 r0 top value="68 pF"
C76 "C0603X5R1E104K030BB" 0201_cap 2543.53,1493.1 r0 bottom value="0.1 uF"
C77 "GJM0335C1HR60WB01D" 0201_cap 2622.68,1493.11 r90 top value="0.6 pF"
C78 "GRM0335C1E680FA01D" 0201_cap 2655.75,1478.11 r0 top value="68 pF"
C79 "GRM0335C1E680FA01D" 0201_cap 2655.75,1271.89 r0 top value="68 pF"
C80 "0201BB104KW160" 0201_cap 2483.53,859.29 r45 top value="0.1 uF"
C81 "0201BB104KW160" 0201_cap 2604.96,1090.46 r45 top value="0.1 uF"
C82 "C0603X5R1E104K030BB" 0201_cap 2613.67,1256.9 r180 bottom value="0.1 uF"
C83 "GJM0335C1HR60WB01D" 0201_cap 2622.68,1256.89 r90 top value="0.6 pF"
C84 "0201BB104KW160" 0201_cap 3570.05,2260 r0 top value="0.1 uF"
C85 "0201BB104KW160" 0201_cap 3570.05,2290 r0 top value="0.1 uF"
C86 "0201BB104KW160" 0201_cap 3570.05,2060 r0 top value="0.1 uF"
C87 "0201BB104KW160" 0201_cap 3570.05,2090 r0 top value="0.1 uF"
C88 "0201BB104KW160" 0201_cap 3570.05,1960 r0 top value="0.1 uF"
C89 "0201BB104KW160" 0201_cap 3570.05,1990 r0 top value="0.1 uF"
C90 "0201BB104KW160" 0201_cap 3570.05,1860 r0 top value="0.1 uF"
C91 "0402ZD106MAT2A" 0402L_cap 2660,1306.38 r90 bottom value="10 uF"
C92 "C0603X5R1E104K030BB" 0201_cap 2648.98,1340 r0 top value="0.1 uF"
C93 "0201BB104KW160" 0201_cap 3570.05,1890 r0 top value="0.1 uF"
C94 "0201BB104KW160" 0201_cap 3570.05,1490 r0 top value="0.1 uF"
C95 "0201BB104KW160" 0201_cap 3570.3,1460 r0 top value="0.1 uF"
C96 "0201BB104KW160" 0201_cap 3570.05,1590 r0 top value="0.1 uF"
C97 "0201BB104KW160" 0201_cap 3570.05,1560 r0 top value="0.1 uF"
C98 "0201BB104KW160" 0201_cap 3570.05,1690 r0 top value="0.1 uF"
C99 "0201BB104KW160" 0201_cap 2626.17,1069.25 r45 top value="0.1 uF"
C100 "0201BB104KW160" 0201_cap 3570.05,1660 r0 top value="0.1 uF"
C101 "0201BB104KW160" 0201_cap 2279.53,1358.23 r0 top value="0.1 uF"
C102 "0201BB104KW160" 0201_cap 3570.05,1790 r0 top value="0.1 uF"
C103 "0201BB104KW160" 0201_cap 1691.27,2117.71 r270 bottom value="0.1 uF"
C104 "0201BB104KW160" 0201_cap 3570.05,1760 r0 top value="0.1 uF"
C105 "0201BB104KW160" 0201_cap 1416.04,1721.9 r270 bottom value="0.1 uF"
C106 "0201BB104KW160" 0201_cap 2554.98,1406.69 r0 top value="0.1 uF"
C107 "C0603X5R1E104K030BB" 0201_cap 1427.06,1237.87 r180 bottom value="0.1 uF"
C108 "C0603X5R1E104K030BB" 0201_cap 1440.04,1272.4 r270 bottom value="0.1 uF"
C109 "0402ZD106MAT2A" 0402L_cap 2701.38,1490 r0 bottom value="10 uF"
C110 "0402ZD106MAT2A" 0402L_cap 3084.62,1394 r180 bottom value="10 uF"
C111 "C0603X5R1E104K030BB" 0201_cap 2700,1556.02 r270 top value="0.1 uF"
C112 "C0603X5R1E104K030BB" 0201_cap 3102.04,1400.21 r180 top value="0.1 uF"
C113 "C0603X5R1E104K030BB" 0201_cap 2662.98,1294.5 r0 top value="0.1 uF"
C114 "0402ZD106MAT2A" 0402L_cap 2701.38,1443.96 r0 bottom value="10 uF"
C115 "0402ZD106MAT2A" 0402L_cap 2801.43,1557.62 r270 bottom value="10 uF"
C116 "C0603X5R1E104K030BB" 0201_cap 2680.02,1443.9 r0 top value="0.1 uF"
C117 "C0603X5R1E104K030BB" 0201_cap 2722.96,1574.55 r270 top value="0.1 uF"
C118 "C0603X5R1E104K030BB" 0201_cap 2725,1168.98 r90 top value="0.1 uF"
C119 "C0603X5R1E104K030BB" 0201_cap 2822,1589.02 r270 top value="0.1 uF"
C120 "0402ZD106MAT2A" 0402L_cap 2703.09,1378.62 r270 bottom value="10 uF"
C121 "C0603X5R1E104K030BB" 0201_cap 2666.98,1364 r0 top value="0.1 uF"
C122 "0402ZD106MAT2A" 0402L_cap 3084.62,1434.71 r180 bottom value="10 uF"
C123 "0402ZD106MAT2A" 0402L_cap 2858.38,1214 r0 bottom value="10 uF"
C124 "C0603X5R1E104K030BB" 0201_cap 3102.04,1428.5 r180 top value="0.1 uF"
C125 "C0603X5R1E104K030BB" 0201_cap 3102.04,1325.79 r180 top value="0.1 uF"
C126 "C0603X5R1E104K030BB" 0201_cap 2919.8,1587.26 r270 top value="0.1 uF"
C127 "C0603X5R1E104K030BB" 0201_cap 2919.53,1162.96 r90 top value="0.1 uF"
C128 "C0603X5R1E104K030BB" 0201_cap 2998.27,1587.04 r270 top value="0.1 uF"
C129 "C0603X5R1E104K030BB" 0201_cap 2880.16,1162.96 r90 top value="0.1 uF"
C130 "C0603X5R1E104K030BB" 0201_cap 2880.43,1587.26 r270 top value="0.1 uF"
C131 "C0603X5R1E104K030BB" 0201_cap 2998.25,1162.95 r90 top value="0.1 uF"
C132 "C0603X5R1E104K030BB" 0201_cap 2456.8,1256.74 r180 bottom value="0.1 uF"
C133 "0201BB104KW160" 0201_cap 1662.82,1118.57 r270 bottom value="0.1 uF"
C134 "0201BB104KW160" 0201_cap 1639.81,1118.57 r270 bottom value="0.1 uF"
C135 "0201BB104KW160" 0201_cap 1541.39,1613.08 r90 bottom value="0.1 uF"
C136 "0201BB104KW160" 0201_cap 1564.39,1613.08 r90 bottom value="0.1 uF"
C137 "0201BB104KW160" 0201_cap 1600.44,1613.08 r90 bottom value="0.1 uF"
C138 "0201BB104KW160" 0201_cap 1623.44,1613.08 r90 bottom value="0.1 uF"
C139 "C0603X5R1E104K030BB" 0201_cap 1810.76,1528.03 r270 top value="0.1 uF"
C140 "C0603X5R1E104K030BB" 0201_cap 1582.42,1516.22 r270 top value="0.1 uF"
C141 "C0603X5R1E104K030BB" 0201_cap 1477.3,1493.78 r0 top value="0.1 uF"
C142 "C0603X5R1E104K030BB" 0201_cap 1477.3,1454.41 r0 top value="0.1 uF"
C143 "C0603X5R1E104K030BB" 0201_cap 1500.92,1395.35 r0 top value="0.1 uF"
C144 "C0603X5R1E104K030BB" 0201_cap 1477.3,1336.3 r0 top value="0.1 uF"
C145 "C0603X5R1E104K030BB" 0201_cap 1500.92,1277.24 r0 top value="0.1 uF"
C146 "C0603X5R1E104K030BB" 0201_cap 1504.83,1218 r0 top value="0.1 uF"
C147 "C0603X5R1E104K030BB" 0201_cap 1621.79,1215.43 r90 top value="0.1 uF"
C148 "C0603X5R1E104K030BB" 0201_cap 1720.21,1215.43 r90 top value="0.1 uF"
C149 "0402ZD106MAT2A" 0402L_cap 1797.68,1334.82 r0 top value="10 uF"
C150 "C0603X5R1E104K030BB" 0201_cap 1793.85,1289.8 r0 top value="0.1 uF"
C151 "C0603X5R1E104K030BB" 0201_cap 1798.95,1215.43 r90 top value="0.1 uF"
C152 "C0603X5R1E104K030BB" 0201_cap 1848.83,1352.44 r90 top value="0.1 uF"
C153 "0201BB104KW160" 0201_cap 2554.98,1383.49 r0 top value="0.1 uF"
C154 "GRM0335C1E680FA01D" 0201_cap 2655.75,1241.89 r0 top value="68 pF"
C155 "GRM0335C1E680FA01D" 0201_cap 2756.89,1140.75 r90 top value="68 pF"
C156 "C0603X5R1E104K030BB" 0201_cap 2771.9,1028.53 r90 bottom value="0.1 uF"
C157 "GJM0335C1HR60WB01D" 0201_cap 2771.89,1107.68 r180 top value="0.6 pF"
C158 "GRM0335C1E680FA01D" 0201_cap 2786.89,1140.75 r90 top value="68 pF"
C159 "C0603X5R1E104K030BB" 0201_cap 314.02,751 r180 top value="0.1 uF"
C160 "C0603X5R1E104K030BB" 0201_cap 2684.91,1209.72 r0 top value="0.1 uF"
C164 "C0603X5R1E104K030BB" 0201_cap 197.49,1504.26 r180 top value="0.1 uF"
C165 "C2012X7S1E106K125AC" 0805L_cap 259.81,1556.88 r180 top value="10 uF"
C166 "04025C222JAT2A" 0402L_cap 259.74,1509.8 r180 top value="2200 pF"
C177 "C2012X7S1E106K125AC" 0805L_cap 281.37,1286.48 r180 top value="10 uF"
C178 "04025C222JAT2A" 0402L_cap 274.3,1333.15 r180 top value="2200 pF"
D1 "SMBJ15CA" SMBJ15CA 382.01,2430 r0 bottom
D2 "MBR130T1G" SOD-123 724.53,2433 r180 bottom
D3 "LTST-C191TGKT" LED_LTST-C190-Green 895.56,2308.78 r270 top
FB1 "BLE18PS080SN1D" 0603L 930.86,248.47 r0 top value=-
FB2 "BLE18PS080SN1D" 0603L 658.56,547 r0 top value=-
FB3 "BLE18PS080SN1D" 0603L 900.98,693.62 r0 top value=-
FB4 "BLE18PS080SN1D" 0603L 922.73,1218.65 r0 top value=-
FB5 "BLE18PS080SN1D" 0603L 658.56,1029.55 r0 top value=-
FB6 "BLE18PS080SN1D" 0603L 900.98,870.87 r0 top value=-
FC1 "dcp00001" NFM31PC 1082.4,412.39 r0 bottom value=27uF
FC3 "dcp00001" NFM31PC 1047.4,658.63 r0 bottom value=27uF
FC4 "dcp00001" NFM31PC 1047.4,1223.38 r0 bottom value=27uF
FC6 "dcp00001" NFM31PC 1047.4,969.89 r0 bottom value=27uF
FID1 "Fiducial Mark" Fiducial10-20 697,1553 r0 top
FID2 "Fiducial Mark" Fiducial10-20 798,463 r0 top
FID3 "Fiducial Mark" Fiducial10-20 4100,2660 r0 top
H5 "2069-440-SS" FP-2116-440-AL_STANDOFF_HEX_1-4-MFG 150,2600 r270 top
H6 "2069-440-SS" FP-2116-440-AL_STANDOFF_HEX_1-4-MFG 150,150 r180 top
H7 "906-200" Bivar_906-200 101.75,378.8 r0 top
H8 "906-200" Bivar_906-200 901.75,378.79 r0 top
H9 "94812A100" MMCNYN256 101.75,378.8 r270 bottom
H10 "94812A100" MMCNYN256 901.75,378.79 r270 bottom
J1 "ASP-134488-01" SAMTEC_ASP-134488-01 3840,1375 r90 top locked
J2 "RAPC722X" RAPC722X -46.83,2265 r0 top
J3 "QSH-030-01-L-D-A" FTDI_Dongle_001 501.75,1153.8 r90 top locked
J4 "SASF546-P26-X1" FP-132134-15_CONN_SMA_JACK-MFG 1691.27,2367.94 r0 top
J5 "SASF546-P26-X1" FP-132134-15_CONN_SMA_JACK-MFG 2242.79,1912.98 r45 top
J6 "SASF546-P26-X1" FP-132134-15_CONN_SMA_JACK-MFG 2352.02,727.79 r45 top
J7 "TSW-102-14-L-S" PBC02SAAN 1264,2608 r90 top
J8 "TSW-102-14-L-S" PBC02SAAN 1264,2448 r90 top
J9 "0853050232" Molex_0853050232 1490.45,1044.51 r0 top
J10 "0853050232" Molex_0853050232 1721.55,1044.51 r0 top
L7 "XGL4020-152MEC" XGL4020 413.65,1423.5 r0 top value="1.5 µH"
LBL1 "THT-14-423-10" Label_650x200 2922,2203 r0 top
Logo1 "Texas Instruments" TI_Stacked_Overlay_Medium 3113,336 r0 top
LOGO2 "CE Mark" CE_Mark_5mm 3223.3,1815.12 r180 bottom
Logo3 "FCC disclaimer" FCC_disclaimer 3540,1690 r90 bottom
Logo4 "WEEE" WEEE_Minimum 3260,2221 r180 bottom
PP1 "Probe Point" ProbePoint_TH_40mil 323.26,331.18 r0 top
PP2 "Probe Point" ProbePoint_TH_40mil 830,307 r90 top
PP3 "Probe Point" ProbePoint_TH_40mil 1156,462.76 r90 bottom
PP4 "Probe Point" ProbePoint_TH_40mil 406,1209 r0 top
PP5 "Probe Point" ProbePoint_TH_40mil 938,645 r90 top
PP6 "Probe Point" ProbePoint_TH_40mil 1121,709 r90 bottom
PP7 "Probe Point" ProbePoint_TH_40mil 960.01,1168.14 r90 top
PP8 "Probe Point" ProbePoint_TH_40mil 1121,1273.74 r90 bottom
PP9 "Probe Point" ProbePoint_TH_40mil 868,1375 r90 top
PP10 "Probe Point" ProbePoint_TH_40mil 355,840 r90 top
PP11 "Probe Point" ProbePoint_TH_40mil 937.96,821.88 r90 top
PP12 "Probe Point" ProbePoint_TH_40mil 1121,1020.26 r90 bottom
PP13 "Probe Point" ProbePoint_TH_40mil 171,1591.98 r0 top
PP14 "Probe Point" ProbePoint_TH_40mil 1987,316 r90 top
PP15 "Probe Point" ProbePoint_TH_40mil 1987,265 r0 top
PP16 "Probe Point" ProbePoint_TH_40mil 1987,112 r0 top
PP17 "Probe Point" ProbePoint_TH_40mil 1987,214 r0 top
PP18 "Probe Point" ProbePoint_TH_40mil 1987,163 r0 top
PP19 "Probe Point" ProbePoint_TH_40mil 2287,315 r90 top
PP20 "Probe Point" ProbePoint_TH_40mil 2287,265 r0 top
PP21 "Probe Point" ProbePoint_TH_40mil 2287,164 r0 top
PP22 "Probe Point" ProbePoint_TH_40mil 2287,113 r0 top
PP23 "Probe Point" ProbePoint_TH_40mil 2905,954 r0 top
PP24 "Probe Point" ProbePoint_TH_40mil 2905,903 r0 top
PP25 "Probe Point" ProbePoint_TH_40mil 2905,852 r0 top
PP26 "Probe Point" ProbePoint_TH_40mil 1687,216 r0 top
PP27 "Probe Point" ProbePoint_TH_40mil 1687,165 r0 top
PP28 "Probe Point" ProbePoint_TH_40mil 2287,215 r0 top
PP29 "Probe Point" ProbePoint_TH_40mil 3462,575 r0 top
PP30 "Probe Point" ProbePoint_TH_40mil 3462,475 r0 top
PP31 "Probe Point" ProbePoint_TH_40mil 1906,1388 r0 top
Q1 "CSD15571Q2" DQK0006C 370,2195 r270 bottom
R1 "CSS0603FT2L00" CCS0603FLxLxx 784,2340 r0 top value="2 mΩ"
R2 "ERJ-1GNF1004C" 0201 419.72,2694 r0 bottom value="1 MΩ"
R3 "ERJ-1GNF2672C" 0201 341.6,2562.46 r0 bottom value="26.7 kΩ"
R4 "ERJ-2RKF1623X" 0402L 338,2700.8 r180 bottom value="162 kΩ"
R5 "ERJ-2RKF4871X" 0402L 377.81,171.91 r0 top value="4.87 kΩ"
R6 "ERA-2APB1542X" 0402L 377.81,241.91 r180 top value="15.4 kΩ"
R7 "ERJ-2RKF4871X" 0402L 895.56,2298.94 r90 bottom value="4.87 kΩ"
R8 "ERJ-PA2F4701X" 0402L 397.49,152.22 r270 top value="4.7 kΩ"
R9 "ERJ-2RKF8062X" 0402L 377.81,206.91 r0 top value="80.6 kΩ"
R10 "ERA-2APB4871X" 0402L 377.81,236.91 r0 bottom value="4.87 kΩ"
R11 "ERJ-PA2F4701X" 0402L 93.38,471.26 r0 top value="4.7 kΩ"
R12 "CSS0603FT2L00" CCS0603FLxLxx 732.43,711 r0 top value="2 mΩ"
R13 "RC0201FS-7D100RL" 0201L 2592.62,1394.69 r270 top value=100
R14 "ERA-2ARB7871X" 0402L 93.38,541.26 r180 top value="7.87 kΩ"
R15 "ERJ-2RKF1822X" 0402L 93.38,506.26 r0 top value="18.2 kΩ"
R16 "ERJ-2RKF5492X" 0402L 843.08,669.4 r90 top value="54.9 kΩ"
R17 "ERA-2APB8061X" 0402L 633.43,636.15 r90 top value="8.06 kΩ"
R18 "ERJ-2RKF1242X" 0402L 840.08,630.03 r90 bottom value="12.4 kΩ"
R19 "ERA-2APB4871X" 0402L 93.38,516.26 r0 bottom value="4.87 kΩ"
R20 "CSS0603FT2L00" CCS0603FLxLxx 677.58,1220.4 r0 top value="2 mΩ"
R21 "ERA-2AEB1182X" 0402L 794.94,1194.5 r90 top value="11.8 kΩ"
R22 "ERA-2ARB2262X" 0402L 736.94,1155.13 r90 top value="22.6 kΩ"
R23 "ERJ-2RKF2212X" 0402L 627.1,1126.26 r270 top value="22.1 kΩ"
R24 "ERJ-1GNF1002C" 0201 1681.39,600.26 r180 bottom value="10 kΩ"
R25 "ERJ-1GNF1002C" 0201 1681.39,577.26 r180 bottom value="10 kΩ"
R26 "CSS0603FT2L00" CCS0603FLxLxx 745.75,1422.36 r0 top value="2 mΩ"
R27 "ERA-2AEB1401X" 0402L 100.46,1368.82 r270 top value="1.4 kΩ"
R28 "ERJ-1GNF1002C" 0201 1715.41,564.24 r270 bottom value="10 kΩ"
R29 "ERJ-1GN0R00C" 0201 1692.41,541.24 r90 bottom value="0 Ω"
R30 "ERA-2VEB1001X" 0402L 134.06,1368.81 r90 top value="1 kΩ"
R31 "ERJ-PA2F4701X" 0402L 93.38,952.51 r0 top value="4.7 kΩ"
R32 "CSS0603FT2L00" CCS0603FLxLxx 740.81,871.48 r0 top value="2 mΩ"
R33 "ERJ-2RKF2212X" 0402L 426.61,635.87 r180 top value="22.1 kΩ"
R34 "ERA-2AEB1182X" 0402L 93.38,1023.45 r180 top value="11.8 kΩ"
R35 "ERJ-2RKF8062X" 0402L 93.38,988.45 r0 top value="80.6 kΩ"
R36 "ERJ-2RKF8872X" 0402L 818.43,894.48 r270 top value="88.7 kΩ"
R37 "ERA-2APB1212X" 0402L 633.42,812.28 r90 top value="12.1 kΩ"
R38 "ERJ-2RKF1242X" 0402L 633.42,937.61 r270 bottom value="12.4 kΩ"
R39 "ERA-2APB4871X" 0402L 93.38,1018.45 r0 bottom value="4.87 kΩ"
R40 "ERJ-1GNF1002C" 0201 511.71,1988.45 r270 bottom value="10 kΩ"
R41 "ERJ-1GNF1002C" 0201 767.51,2099.43 r180 bottom value="10 kΩ"
R42 "ERJ-1GNF1002C" 0201 483.13,1988.09 r90 bottom value="10 kΩ"
R43 "ERJ-1GNF1002C" 0201 452.65,1988.45 r90 bottom value="10 kΩ"
R44 "ERJ-1GNF1002C" 0201 542.18,1988.09 r90 bottom value="10 kΩ"
R45 "ERJ-1GNF1000C" 0201 2052.65,265.05 r0 bottom value="100 Ω"
R46 "ERJ-1GNF1000C" 0201 2052.65,112.05 r0 bottom value="100 Ω"
R47 "ERJ-1GNF1002C" 0201 1008.25,2370.25 r270 bottom value="10 kΩ"
R48 "ERJ-1GNF1000C" 0201 2052.65,214.05 r0 bottom value="100 Ω"
R49 "ERJ-1GNF1000C" 0201 2052.65,163.05 r0 bottom value="100 Ω"
R50 "ERJ-1GNF1002C" 0201 671.37,2158.33 r90 bottom value="10 kΩ"
R51 "ERJ-1GNF1002C" 0201 767.51,2067.94 r0 bottom value="10 kΩ"
R52 "ERJ-1GNF1002C" 0201 687.12,1993.29 r270 bottom value="10 kΩ"
R53 "ERJ-1GNF1002C" 0201 3906.02,1100 r0 top value="10 kΩ"
R54 "ERJ-1GNF1002C" 0201 3956.02,1100 r0 top value="10 kΩ"
R55 "ERJ-1GN0R00C" 0201 456.82,1580.62 r180 top value="0 Ω"
R56 "ERJ-1GNF1002C" 0201 983.21,2100.4 r180 bottom value="10 kΩ"
R57 "ERJ-1GNF1002C" 0201 1049.02,2031 r180 bottom value="10 kΩ"
R58 "ERJ-1GNF1000C" 0201 2353.26,264.77 r0 bottom value="100 Ω"
R59 "ERJ-1GNF1000C" 0201 2353.26,163.77 r0 bottom value="100 Ω"
R60 "ERJ-1GNF1000C" 0201 957.02,2141.11 r90 bottom value="100 Ω"
R61 "ERJ-1GNF1000C" 0201 2353.02,113 r0 bottom value="100 Ω"
R62 "ERJ-1GNF1000C" 0201 1048.61,2006.17 r0 bottom value="100 Ω"
R63 "ERJ-1GNF1002C" 0201 881.79,2015.28 r180 bottom value="10 kΩ"
R64 "ERJ-1GNF1001C" 0201 926,2100 r180 bottom value="1 kΩ"
R65 "ERJ-1GNF1002C" 0201 2897,2214.98 r90 bottom value="10 kΩ"
R66 "ERJ-1GNF1002C" 0201 577.47,2083.68 r180 bottom value="10 kΩ"
R67 "ERJ-1GN0R00C" 0201 3865.97,2384 r0 top value="0 Ω"
R68 "ERJ-1GNF2201C" 0201 116,2063.76 r180 bottom value="2.2 kΩ"
R69 "ERJ-1GNF2201C" 0201 172.74,2063.76 r0 bottom value="2.2 kΩ"
R70 "ERJ-1GN0R00C" 0201 3915,874.98 r270 top value="0 Ω"
R71 "ERJ-1GN0R00C" 0201 3956.02,900 r0 top value="0 Ω"
R72 "ERJ-1GN0R00C" 0201 3956.02,850 r0 top value="0 Ω"
R73 "ERJ-1GN0R00C" 0201 127.03,2124.78 r90 bottom value="0 Ω"
R74 "ERJ-1GNF1000C" 0201 2613.77,1315.94 r270 top value="100 Ω"
R75 "ERJ-2RKF4871X" 0402L 3756.02,700 r0 top value="4.87 kΩ"
R76 "ERJ-2RKF4871X" 0402L 173.83,1272.74 r180 top value="4.87 kΩ"
R77 "ERJ-1GN0R00C" 0201 161.71,2124.78 r90 bottom value="0 Ω"
R78 "ERJ-2RKF4871X" 0402L 173.83,1238.74 r0 top value="4.87 kΩ"
R79 "ERJ-2RKF4871X" 0402L 962.1,1827.81 r90 top value="4.87 kΩ"
R80 "ERJ-1GNF2200C" 0201 432.98,1555.95 r180 top value="220 Ω"
R81 "ERJ-1GNF1002C" 0201 999.02,1938 r180 bottom value="10 kΩ"
R82 "ERJ-1GNF2201C" 0201 513.27,1573.05 r270 top value="2.2 kΩ"
R83 "ERJ-1GNF1002C" 0201 998.84,1913.48 r180 bottom value="10 kΩ"
R84 "ERJ-1GNF1002C" 0201 936.21,1591.73 r270 top value="10 kΩ"
R85 "ERJ-1GNF1002C" 0201 988.21,1659.45 r90 top value="10 kΩ"
R88 "ERJ-1GNF1000C" 0201 1056,1763 r90 top value="100 Ω"
R90 "ERJ-1GNF2201C" 0201 545.28,1544.98 r90 bottom value="2.2 kΩ"
R91 "ERJ-1GN0R00C" 0201 570.28,1544.98 r270 bottom value="0 Ω"
R92 "ERJ-1GNF1002C" 0201 41.04,2359.27 r270 bottom value="10 kΩ"
R93 "ERJ-1GNF1002C" 0201 91.79,2359.18 r270 bottom value="10 kΩ"
R94 "ERJ-1GNF1002C" 0201 64.84,2359.19 r90 bottom value="10 kΩ"
R95 "ERJ-1GNF1002C" 0201 114.84,2359.08 r90 bottom value="10 kΩ"
R96 "ERJ-1GNF1002C" 0201 144.53,2359.08 r90 bottom value="10 kΩ"
R97 "ERJ-1GNF2201C" 0201 480.02,1555.95 r0 top value="2.2 kΩ"
R99 "RC0201FR-078R66L" 0201 2630.88,1592.19 r315 bottom value="8.66 Ω"
R100 "ERJ-2RKF2212X" 0402L 426.61,812.12 r180 top value="22.1 kΩ"
R101 "RC0201FR-078R66L" 0201 2756.89,1675.37 r270 top value="8.66 Ω"
R102 "ERJ-1GNF1400C" 0201 2756.89,1675.37 r90 bottom value="140 Ω"
R103 "ERJ-1GNF1001C" 0201 2616.19,1628.11 r225 top value="1 kΩ"
R104 "ERJ-1GNF1001C" 0201 2771.89,1578.23 r180 top value="1 kΩ"
R105 "ERJ-1GNF1400C" 0201 2786.89,1675.37 r270 bottom value="140 Ω"
R106 "RC0201FR-078R66L" 0201 2652.1,1613.4 r315 bottom value="8.66 Ω"
R107 "RC0201FR-078R66L" 0201 2786.89,1675.37 r270 top value="8.66 Ω"
R108 "RC0201FR-078R66L" 0201 2618.51,1646.99 r135 bottom value="8.66 Ω"
R109 "RC0201FR-078R66L" 0201 2589.63,1508.11 r0 top value="8.66 Ω"
R110 "ERJ-1GNF1400C" 0201 2567.58,1508.11 r0 bottom value="140 Ω"
R111 "ERJ-1GNF1001C" 0201 2686.77,1493.11 r90 top value="1 kΩ"
R112 "ERJ-1GNF1400C" 0201 2567.58,1478.11 r180 bottom value="140 Ω"
R113 "RC0201FR-078R66L" 0201 2597.3,1625.78 r135 bottom value="8.66 Ω"
R114 "RC0201FR-078R66L" 0201 2589.63,1478.11 r0 top value="8.66 Ω"
R115 "RC0201FR-078R66L" 0201 2651.6,1137.1 r45 bottom value="8.66 Ω"
R116 "RC0201FR-078R66L" 0201 2589.63,1271.89 r0 top value="8.66 Ω"
R117 "ERJ-1GNF1400C" 0201 2589.63,1271.89 r180 bottom value="140 Ω"
R118 "ERJ-1GNF1001C" 0201 2636.89,1101.19 r315 top value="1 kΩ"
R119 "ERJ-1GNF1001C" 0201 2686.77,1256.89 r90 top value="1 kΩ"
R120 "ERJ-1GNF1400C" 0201 2589.63,1241.89 r0 bottom value="140 Ω"
R121 "RC0201FR-078R66L" 0201 2672.81,1115.88 r45 bottom value="8.66 Ω"
R122 "RC0201FR-078R66L" 0201 2589.63,1241.89 r0 top value="8.66 Ω"
R123 "RC0201FR-078R66L" 0201 2618.01,1103.51 r225 bottom value="8.66 Ω"
R124 "RC0201FR-078R66L" 0201 2756.89,1074.63 r90 top value="8.66 Ω"
R125 "ERJ-1GNF1400C" 0201 2756.89,1052.58 r90 bottom value="140 Ω"
R126 "ERJ-1GNF1001C" 0201 2771.89,1171.77 r180 top value="1 kΩ"
R127 "ERJ-1GNF1000C" 0201 1917.95,1065.34 r270 bottom value="100 Ω"
R128 "ERJ-1GNF1000C" 0201 1988.38,1160.46 r0 bottom value="100 Ω"
R129 "ERJ-1GN0R00C" 0201 1905.93,1035.99 r180 bottom value="0 Ω"
R130 "ERJ-1GNF1400C" 0201 2786.89,1052.58 r270 bottom value="140 Ω"
R131 "RC0201FR-078R66L" 0201 2639.22,1082.3 r225 bottom value="8.66 Ω"
R132 "ERJ-1GNF16R0C" 0201 1726.45,2012.83 r315 bottom value="16 Ω"
R133 "ERJ-1GN0R00C" 0201 1681.39,552.26 r0 bottom value="0 Ω"
R134 "ERJ-1GNF16R0C" 0201 1691.49,2068.12 r270 bottom value="16 Ω"
R135 "ERJ-1GNF16R0C" 0201 1656.84,2012.83 r225 bottom value="16 Ω"
R140 "ERJ-1GNF2200C" 0201 3691,2403.02 r270 top value="220 Ω"
R141 "ERJ-1GNF1000C" 0201 2037.76,1160.46 r0 bottom value="100 Ω"
R142 "ERJ-1GN0R00C" 0201 1905.93,1094.68 r180 bottom value="0 Ω"
R143 "ERJ-1GNF49R9C" 0201 1917.95,1123.71 r270 bottom value="49.9 Ω"
R144 "ERJ-1GNF49R9C" 0201 1917.95,1006.97 r90 bottom value="49.9 Ω"
R145 "ERJ-1GNF49R9C" 0201 1404.02,1260.87 r0 bottom value="49.9 Ω"
R146 "ERJ-1GN0R00C" 0201 1909.59,1244.88 r270 bottom value="0 Ω"
R147 "ERJ-1GN0R00C" 0201 1909.59,1289.92 r90 bottom value="0 Ω"
R148 "ERJ-1GNF5600C" 0201 1864.54,1267.4 r270 bottom value="560 Ω"
R149 "ERJ-1GN0R00C" 0201 1898.57,1278.9 r180 bottom value="0 Ω"
R150 "ERJ-1GN0R00C" 0201 1898.57,1255.9 r180 bottom value="0 Ω"
R151 "ERJ-1GNF5600C" 0201 1651.31,1152.6 r180 bottom value="560 Ω"
R152 "ERJ-1GNF5600C" 0201 1552.89,1579.05 r0 bottom value="560 Ω"
R153 "ERJ-1GNF5600C" 0201 1611.95,1579.05 r0 bottom value="560 Ω"
R154 "ERJ-1GNF1002C" 0201 1917.02,1350 r0 top value="10 kΩ"
R155 "ERJ-2RKF2212X" 0402L 115.78,1423.5 r180 top value="22.1 kΩ"
R157 "ERJ-1GN0R00C" 0201 1752.58,1624.1 r0 bottom value="0 Ω"
R158 "ERJ-1GN0R00C" 0201 1707.53,1624.1 r180 bottom value="0 Ω"
R159 "ERJ-1GNF5600C" 0201 1730.06,1579.05 r0 bottom value="560 Ω"
R160 "ERJ-1GN0R00C" 0201 1718.56,1613.08 r270 bottom value="0 Ω"
R161 "ERJ-1GN0R00C" 0201 1741.56,1613.08 r270 bottom value="0 Ω"
R162 "ERJ-1GNF1000C" 0201 2108.19,1045.65 r90 bottom value="100 Ω"
R163 "ERJ-1GNF1000C" 0201 2138.19,1090.03 r90 bottom value="100 Ω"
R164 "RC0201FR-078R66L" 0201 2786.89,1074.63 r90 top value="8.66 Ω"
R177 "ERJ-1GNF1002C" 0201 243.07,1820.35 r0 bottom value="10 kΩ"
R181 "ERJ-2RKF4871X" 0402L 115.78,1458.5 r0 top value="4.87 kΩ"
R182 "ERJ-2RKF1742X" 0402L 115.78,1493.5 r0 top value="17.4 kΩ"
SH-J7 "SPC02SYAN" SPC02SYAN 1264.44,2607.91 r180 top value=1x2
SH-J8 "SPC02SYAN" SPC02SYAN 1264.75,2448.21 r180 top value=1x2
SW1 "1101M2S3CGE2" FP-1101M2S3CGE2_SIP3-MFG 769.04,2601 r270 top
SW3 "434123050816" 434123050816 1597,402 r180 top
T1 "TCM2-33WX+" "DB1627 - Vias 1,2,5" 2512.11,1732.99 r315 top locked
T2 "TCM2-33WX+" "DB1627 - Vias 1,2,5" 2532.01,997.11 r45 top locked
T3 "TCM2-33WX+" "DB1627 - Vias 1,2,5" 2405.51,1394.86 r0 top locked
TP3 "5011" Keystone5011 1215,2095 r270 top
TP4 "5011" Keystone5011 3931,195 r270 top
U1 "ADC32RF55RTD" RTD0064L 2890,1375 r270 top
U2 "LMK04832NKD" NKD0064A 1651.32,1365.82 r180 bottom locked
U3 "TPS259261DRC" DRC0010J 429.29,2612.58 r270 bottom
U4 "TPSM82913RDUR" RDU0028A 547.36,231.28 r90 top
U5 "INA231AYFF" YFF0012AKAD 740.44,647.5 r180 top
U6 "TPSM82913RDUR" RDU0028A 262.93,530.63 r90 top
U7 "TPS7A9401DSC" DSC0010 538.31,682.61 r0 top
U8 "INA231AYFF" YFF0012AKAD 677.93,1132.76 r180 top
U9 "TPS7A5301RPSR" RPS0012A-MFG 552.73,1175.95 r0 top
U10 "INA231AYFF" YFF0012AKAD 753.43,1358.58 r180 top
U11 "TPS3840DL16DBV" DBV0005A 1614.9,448.32 r90 bottom
U12 "INA231AYFF" YFF0012AKAD 748.88,807.7 r180 top
U13 "cmp00201" RDU0028A 262.93,1012.82 r90 top
U14 "TPS7A9401DSC" DSC0010 538.31,858.87 r0 top
U15 "TLV755185PDQNR" DQN0004A 810.94,1056.8 r180 top
U16 "SN74CBTLV3257RSV" RSV0016A 679.24,2075.81 r270 bottom
U17 "SN74AVC4T774RSV" RSV0016A 1015.62,2288.47 r270 bottom
U18 "SN74CBTLV3257RSV" RSV0016A 964.31,2023.16 r0 bottom
U19 "SN74LVC1G126DRL" DRL0005A 1022.1,2156.42 r180 bottom
U20 "TMUX154ERSW" RSW0010A 72,1862 r0 bottom
U21 "SN74AVC4T774RSV" RSV0016A 1086,1650 r0 top
U22 "SN74LVC1G126DRL" DRL0005A 992,1759 r0 top
U23 "SN74AVC4T774RSV" RSV0016A 228,1738 r180 bottom
U25 "24LC64FT-I/MNY" TDFN8 124.68,2244 r270 bottom
U26 "SN74LVC1G125DRL" DRL0005A 461.31,1543.87 r90 bottom
U27 "SN74AUP1G08DRY" DRY0006A 1623.65,576.92 r180 bottom
U28 "LMK1D1204" RGT0016C 2013.07,1065.34 r90 bottom
U29 "TMP117AIYBGR" YBG0006AJAP 2456.13,1208 r0 bottom
U30 "INA231AYFF" YFF0012AKAD 791.68,2276.22 r180 top
U31 "TPS543620RPYR" RPY0014A 231.07,1423.5 r0 top
U32 "SN74CBTLV3257RSV" RSV0016A 2812,2216 r90 bottom
U33 "TMP117AIYBGR" YBG0006AJAP 294.75,781.87 r90 top
ZZ1 "This Assembly Note is for PCB labels only. PLACE ON TOP OF BOARD." AssemblyNoteLabel 376,6929 r0 top
ZZ2 "These assemblies are ESD sensitive, ESD precautions shall be observed." AssemblyNote 376,6849 r0 top
ZZ3 "These assemblies must be clean and free from flux and all contaminants. Use of no clean flux is not acceptable." AssemblyNote 376,6689 r0 top
ZZ4 "These assemblies must comply with workmanship standards IPC-A-610 Class 2, unless otherwise specified." AssemblyNote 376,6769 r0 top

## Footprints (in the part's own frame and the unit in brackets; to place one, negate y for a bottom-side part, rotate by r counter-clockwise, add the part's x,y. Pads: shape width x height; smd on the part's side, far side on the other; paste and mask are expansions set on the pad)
0201 [mm] "Data from Kemet datasheet CC101_COM dated 7/28/11"
  rect 0.36x0.32 smd mask+0.048: 1(-0.28,0) 2(0.28,0)
  body extent -0.31,-0.16 0.31,0.16, height 0.26
0201_cap [mm] "Data from Kemet datasheet CC101_COM dated 7/28/11"
  rect 0.36x0.32 smd mask+0.048: 1(-0.28,0) 2(0.28,0)
  body extent -0.31,-0.16 0.31,0.16, height 0.26
0201L [mm] "Data from Kemet datasheet CC101_COM dated 7/28/11"
  rect 0.36x0.32 smd mask+0.048: 1(-0.28,0) 2(0.28,0)
  body extent -0.31,-0.16 0.31,0.16, height 0.26
0402L [mm] "0402 from SM-752 data"
  rect 0.6x0.5 smd: 1(-0.5,0) 2(0.5,0)
  body extent -0.55,-0.3 0.55,0.3, height 0.6
0402L_cap [mm] "0402 from SM-752 data"
  rect 0.6x0.5 smd: 1(-0.5,0) 2(0.5,0)
  body extent -0.55,-0.3 0.55,0.3, height 0.6
0603L [mm] "0603 from SM-752 data"
  rect 0.8x0.85 smd: 1(-0.7,0) 2(0.7,0)
  silkscreen extent -0.07,-0.32 0.07,0.32, body extent -0.87,-0.47 0.87,0.47, height 1
0805L_cap [mm] "0805 from SM-752 data"
  rect 1.1x1.4 smd: 1(-0.75,0) 2(0.75,0)
  body extent -1.1,-0.72 1.1,0.72, height 1.45
434123050816 [mm] "SWITCH TACTILE SPST-NO 0.05A 12V"
  rrect10% 2x1.5 smd mask+0.05: 1(-2.7,0) 2(2.7,0)
  body extent -2.7,-1.47 2.7,1.47, height 3.23
AssemblyNote [mil] "Assembly Note"
AssemblyNoteLabel [mil] "Assembly Note for PCB Labels"
Bivar_906-200 [mm] "Nylon Spacer"
  round 2 hole 2.45 unplated: 4(0,0)
  body extent -1.88,-1.88 1.88,1.88, height 5.08
CCS0603FLxLxx [mm]
  rrect33% 1.41x0.92 smd: 1(-0.9,0) 2(0.89,0)
  body extent -0.93,-0.52 0.93,0.52, height 0.66
CE_Mark_5mm [mil] "Minimum text height for CE Mark"
  silkscreen extent -138,-98 138,98
"DB1627 - Vias 1,2,5" [mm]
  rrect10% 0.76x1.65 smd: 1(-1.27,1.59) 2(0,1.59) 3(1.27,1.59) 4(1.27,-1.59) 5(0,-1.59) 6(-1.27,-1.59)
  round 0.635 hole 0.381 mask+0.05: 5(-2.54,0) 5(-1.27,2.87) 5(-1.27,0) 5(-1.27,4.242) 5(0,0) 5(0,4.242) 5(0,2.87) 5(0,-2.87) 5(0,-4.242) 5(1.27,0)
  silkscreen extent -1.9,-1.91 1.9,3.09, body extent -1.91,-1.91 1.9,1.9, height 3.13
DBV0005A [mm] "SOT23, 5-Leads, Body 2.9x1.6mm, Pitch 0.95mm, Lead Span 2.8mm, IPC High Density"
  rrect18% 1.1x0.6 smd mask+0.07: 1(-1.3,0.95) 2(-1.3,0) 3(-1.3,-0.95) 4(1.3,-0.95) 5(1.3,0.95)
  silkscreen extent -0.35,-1.55 0.35,1.55, body extent -1.42,-1.46 1.42,1.46, height 1.09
